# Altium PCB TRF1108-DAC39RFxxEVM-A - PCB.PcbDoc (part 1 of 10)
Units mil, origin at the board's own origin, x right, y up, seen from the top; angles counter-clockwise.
Board outline 4951.22 x 2726.56 mil, 16 copper layers (Top Layer, L2 GND1, L3 PWR1, L4 GND2, L5 PWR2, L6 GND3, L7 Ctrl Signal 1, L8 GND4, L9 GND5, L10 Ctrl Signal 2, L11 GND6, L12 PWR3, L13 GND7, L14 PWR4, L15 GND8, Bottom Layer), stack 80.2 mil thick; 705 components, 433 nets, 3633 pads, 1678 vias.
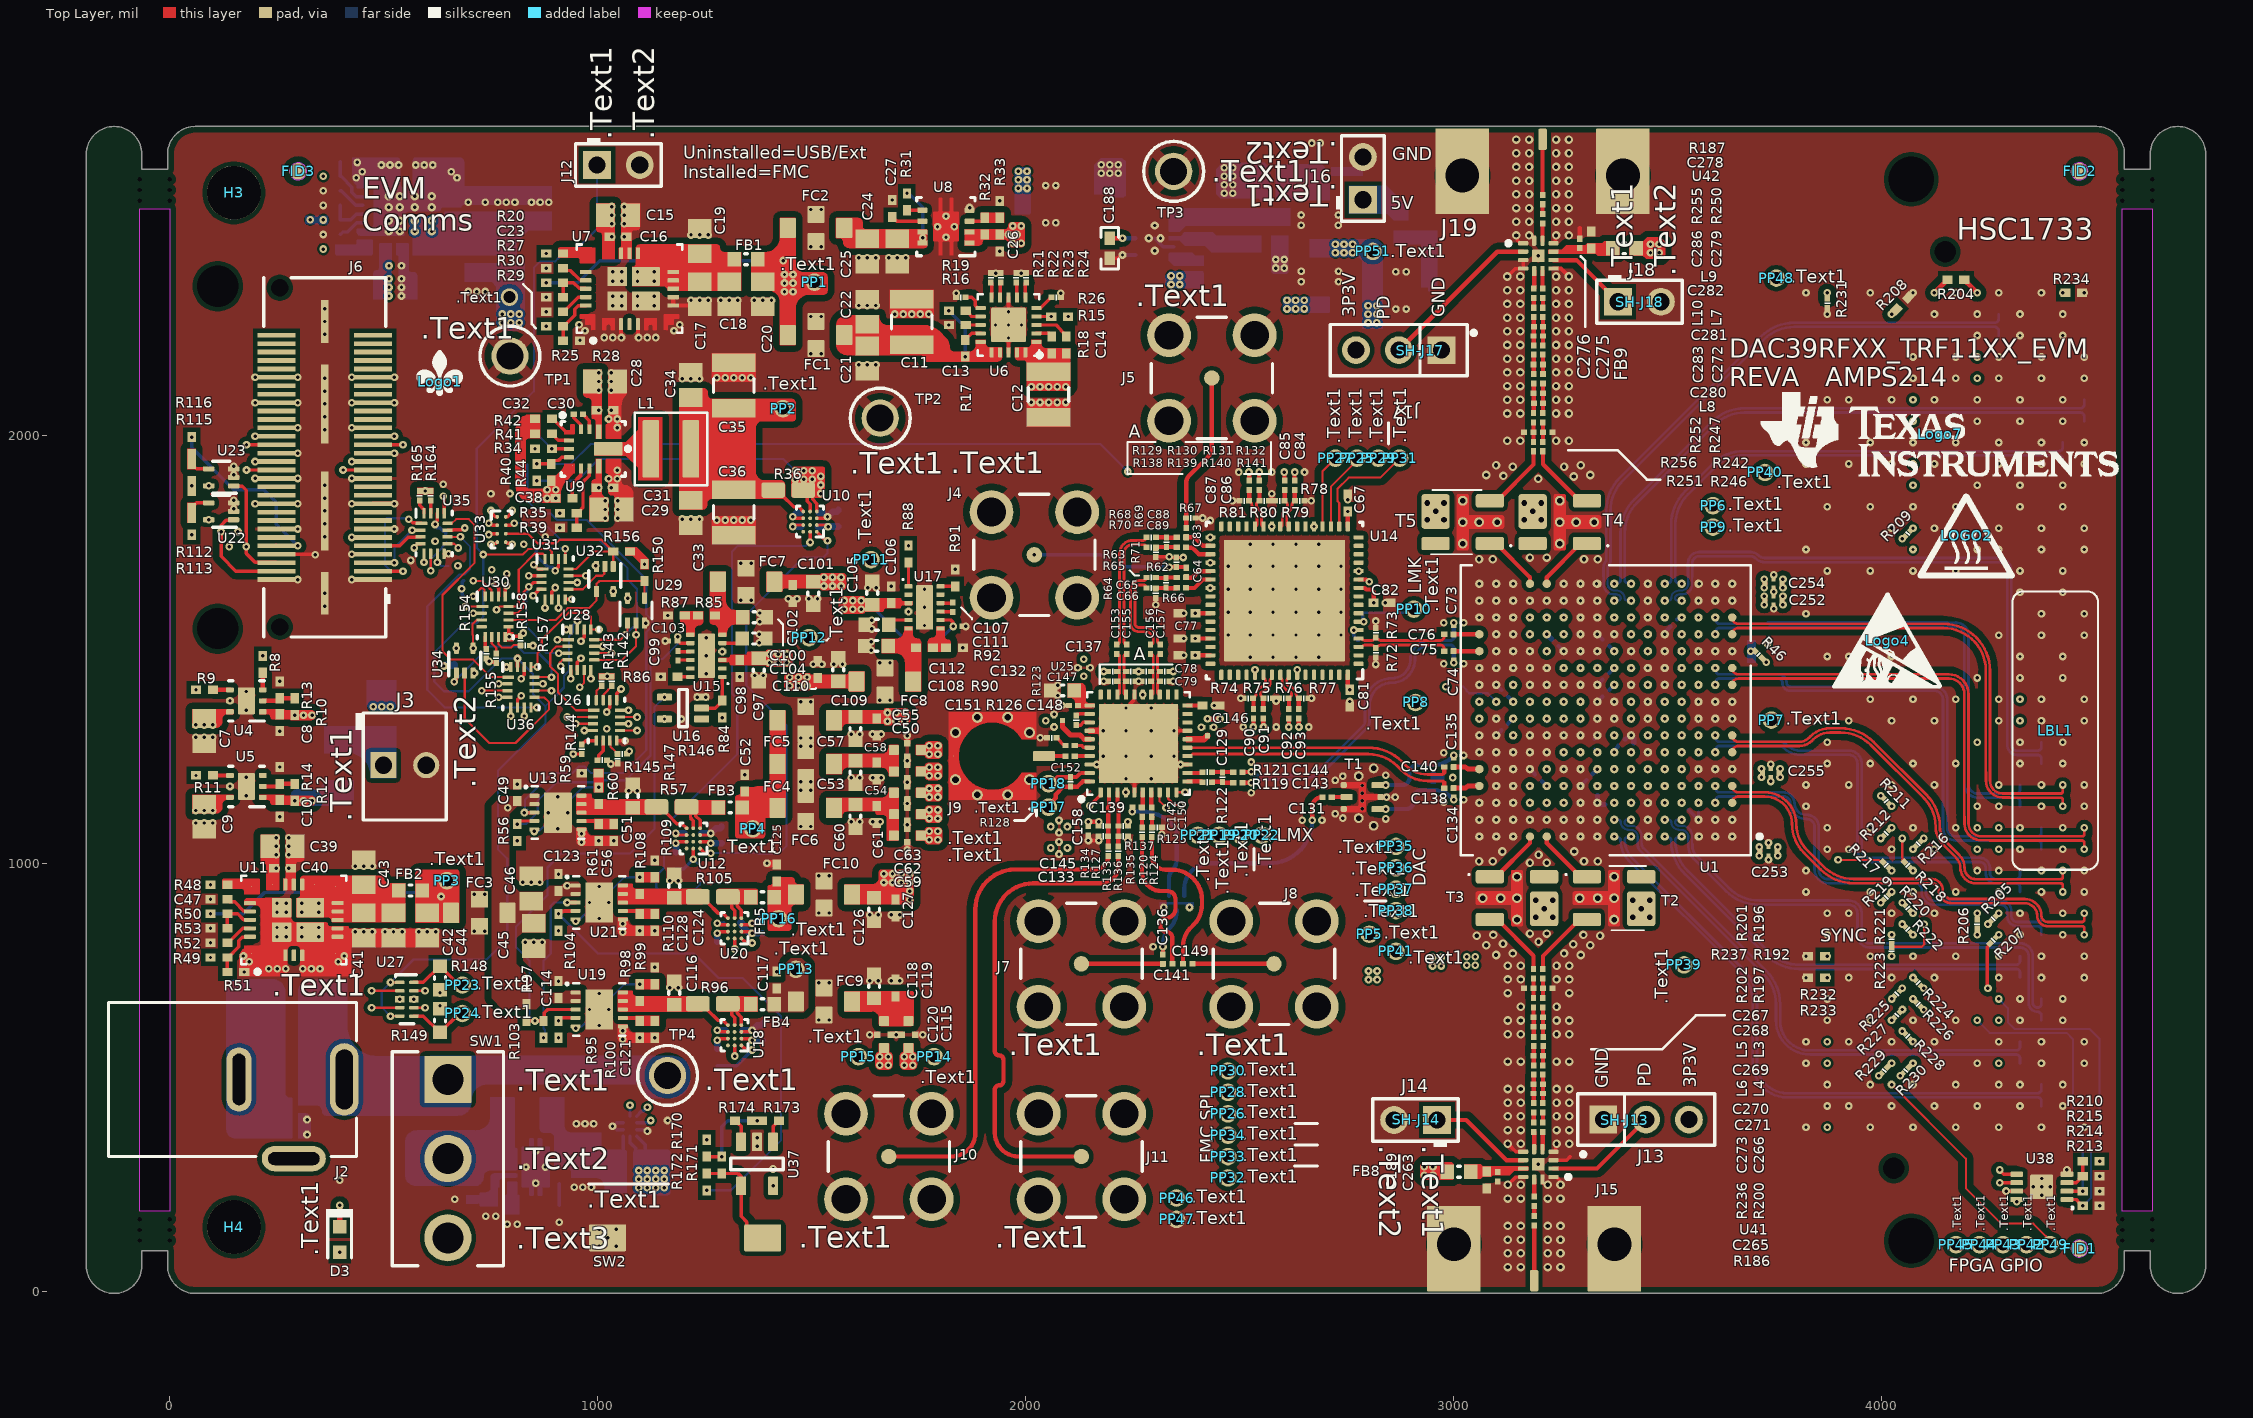
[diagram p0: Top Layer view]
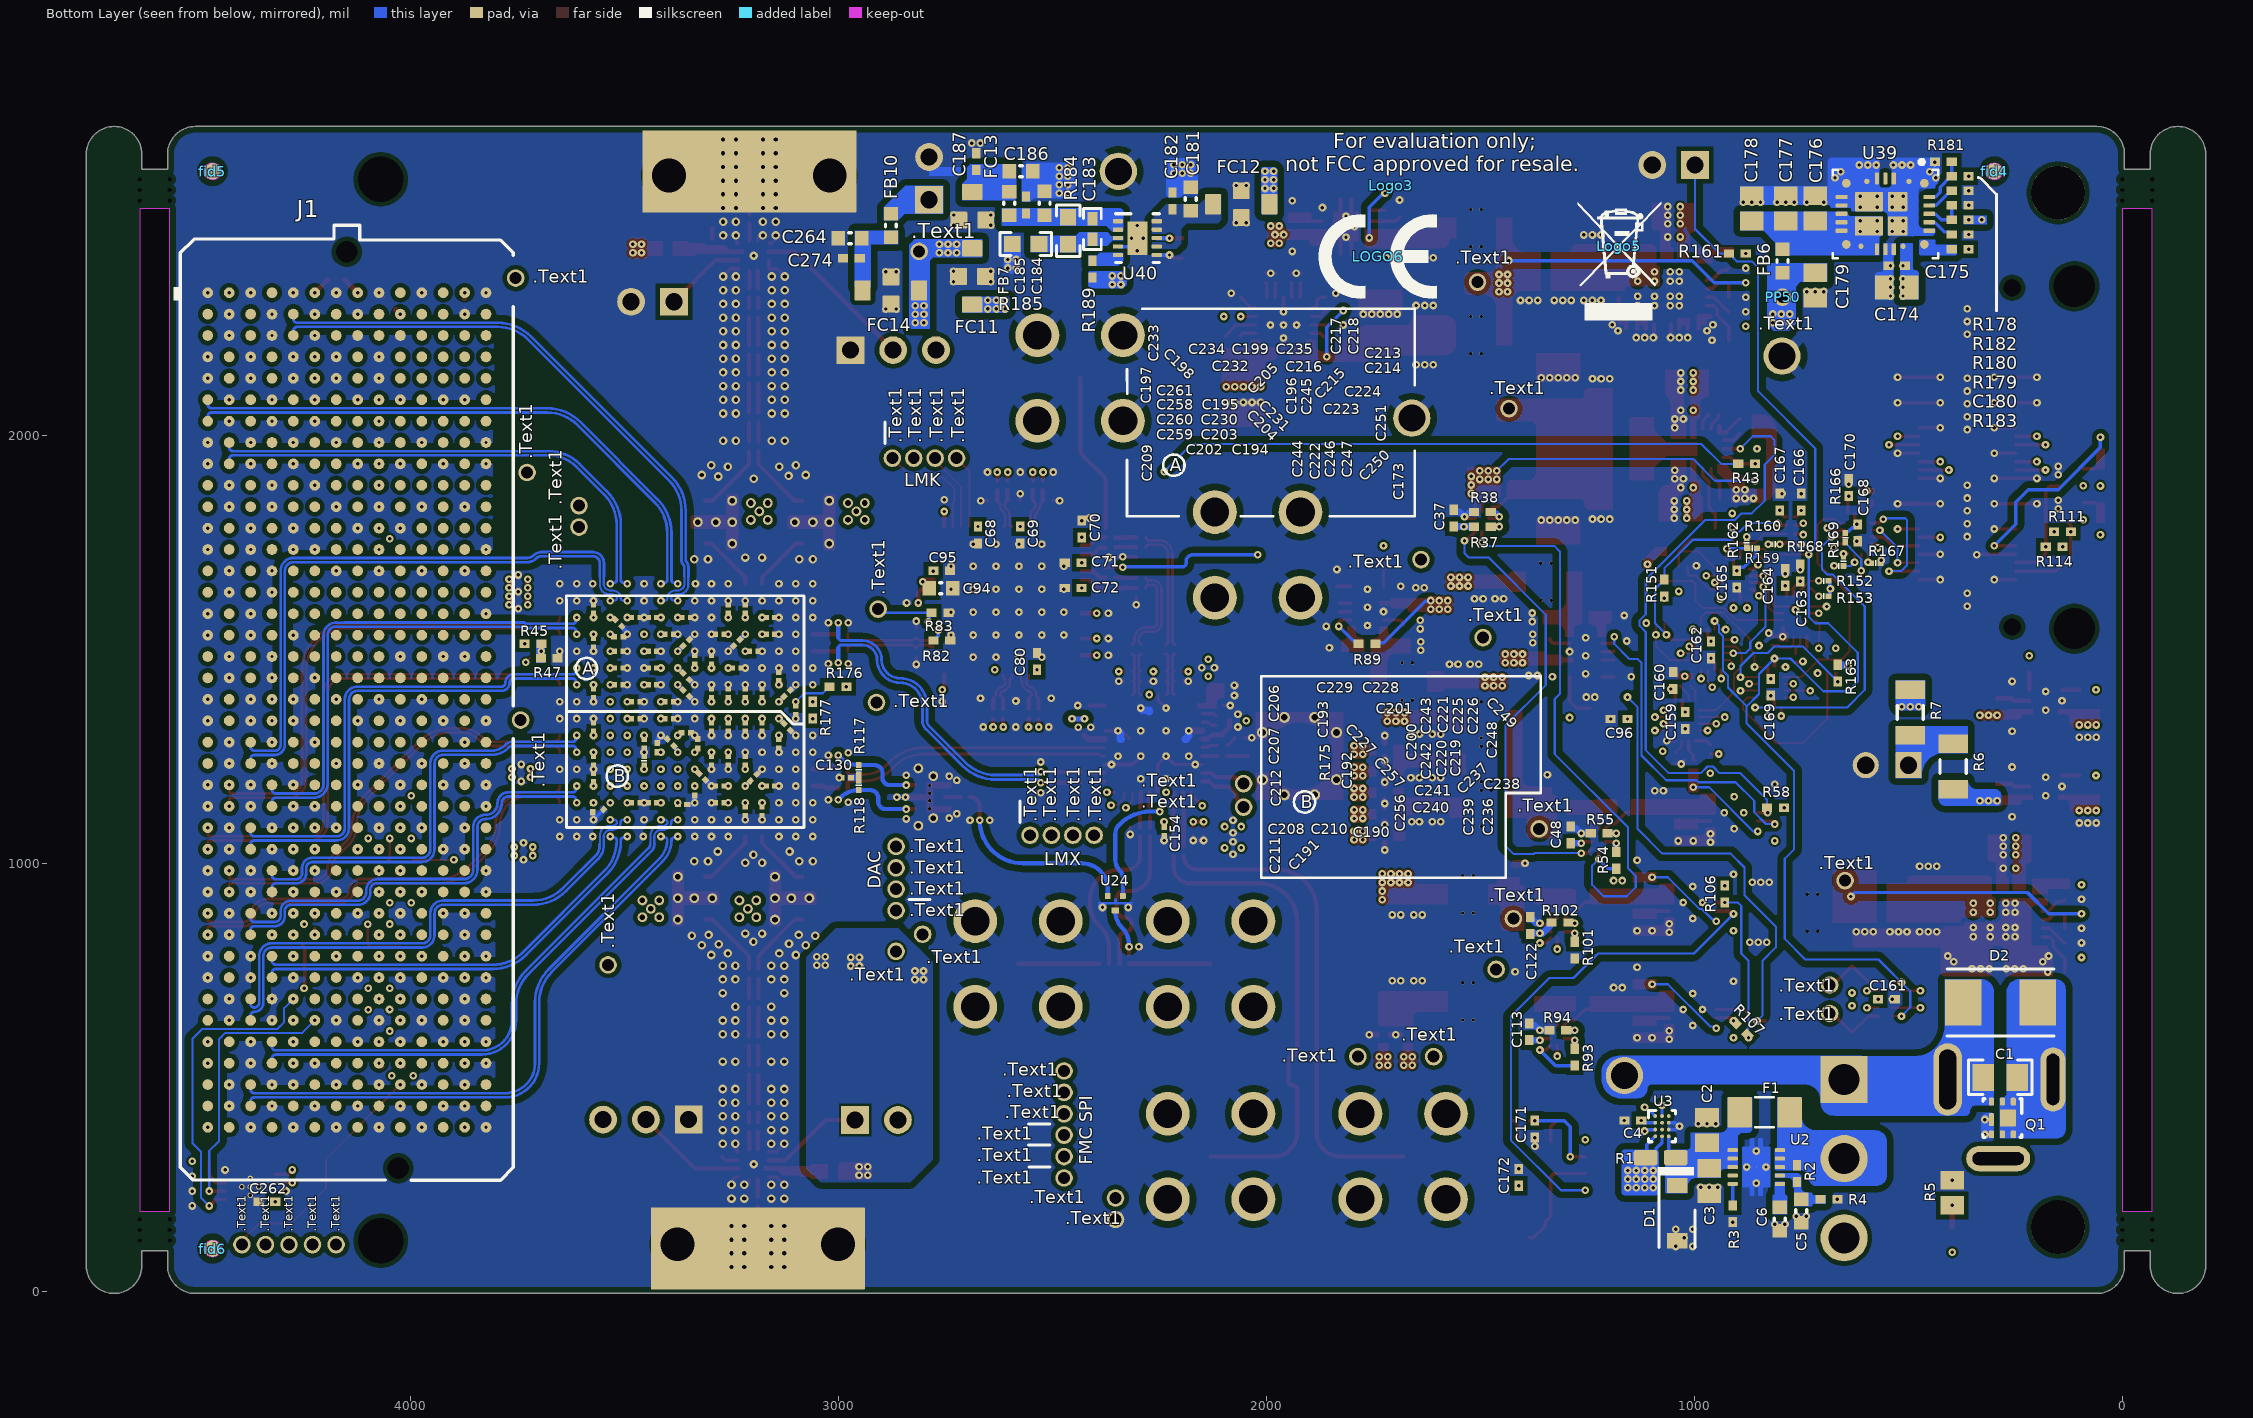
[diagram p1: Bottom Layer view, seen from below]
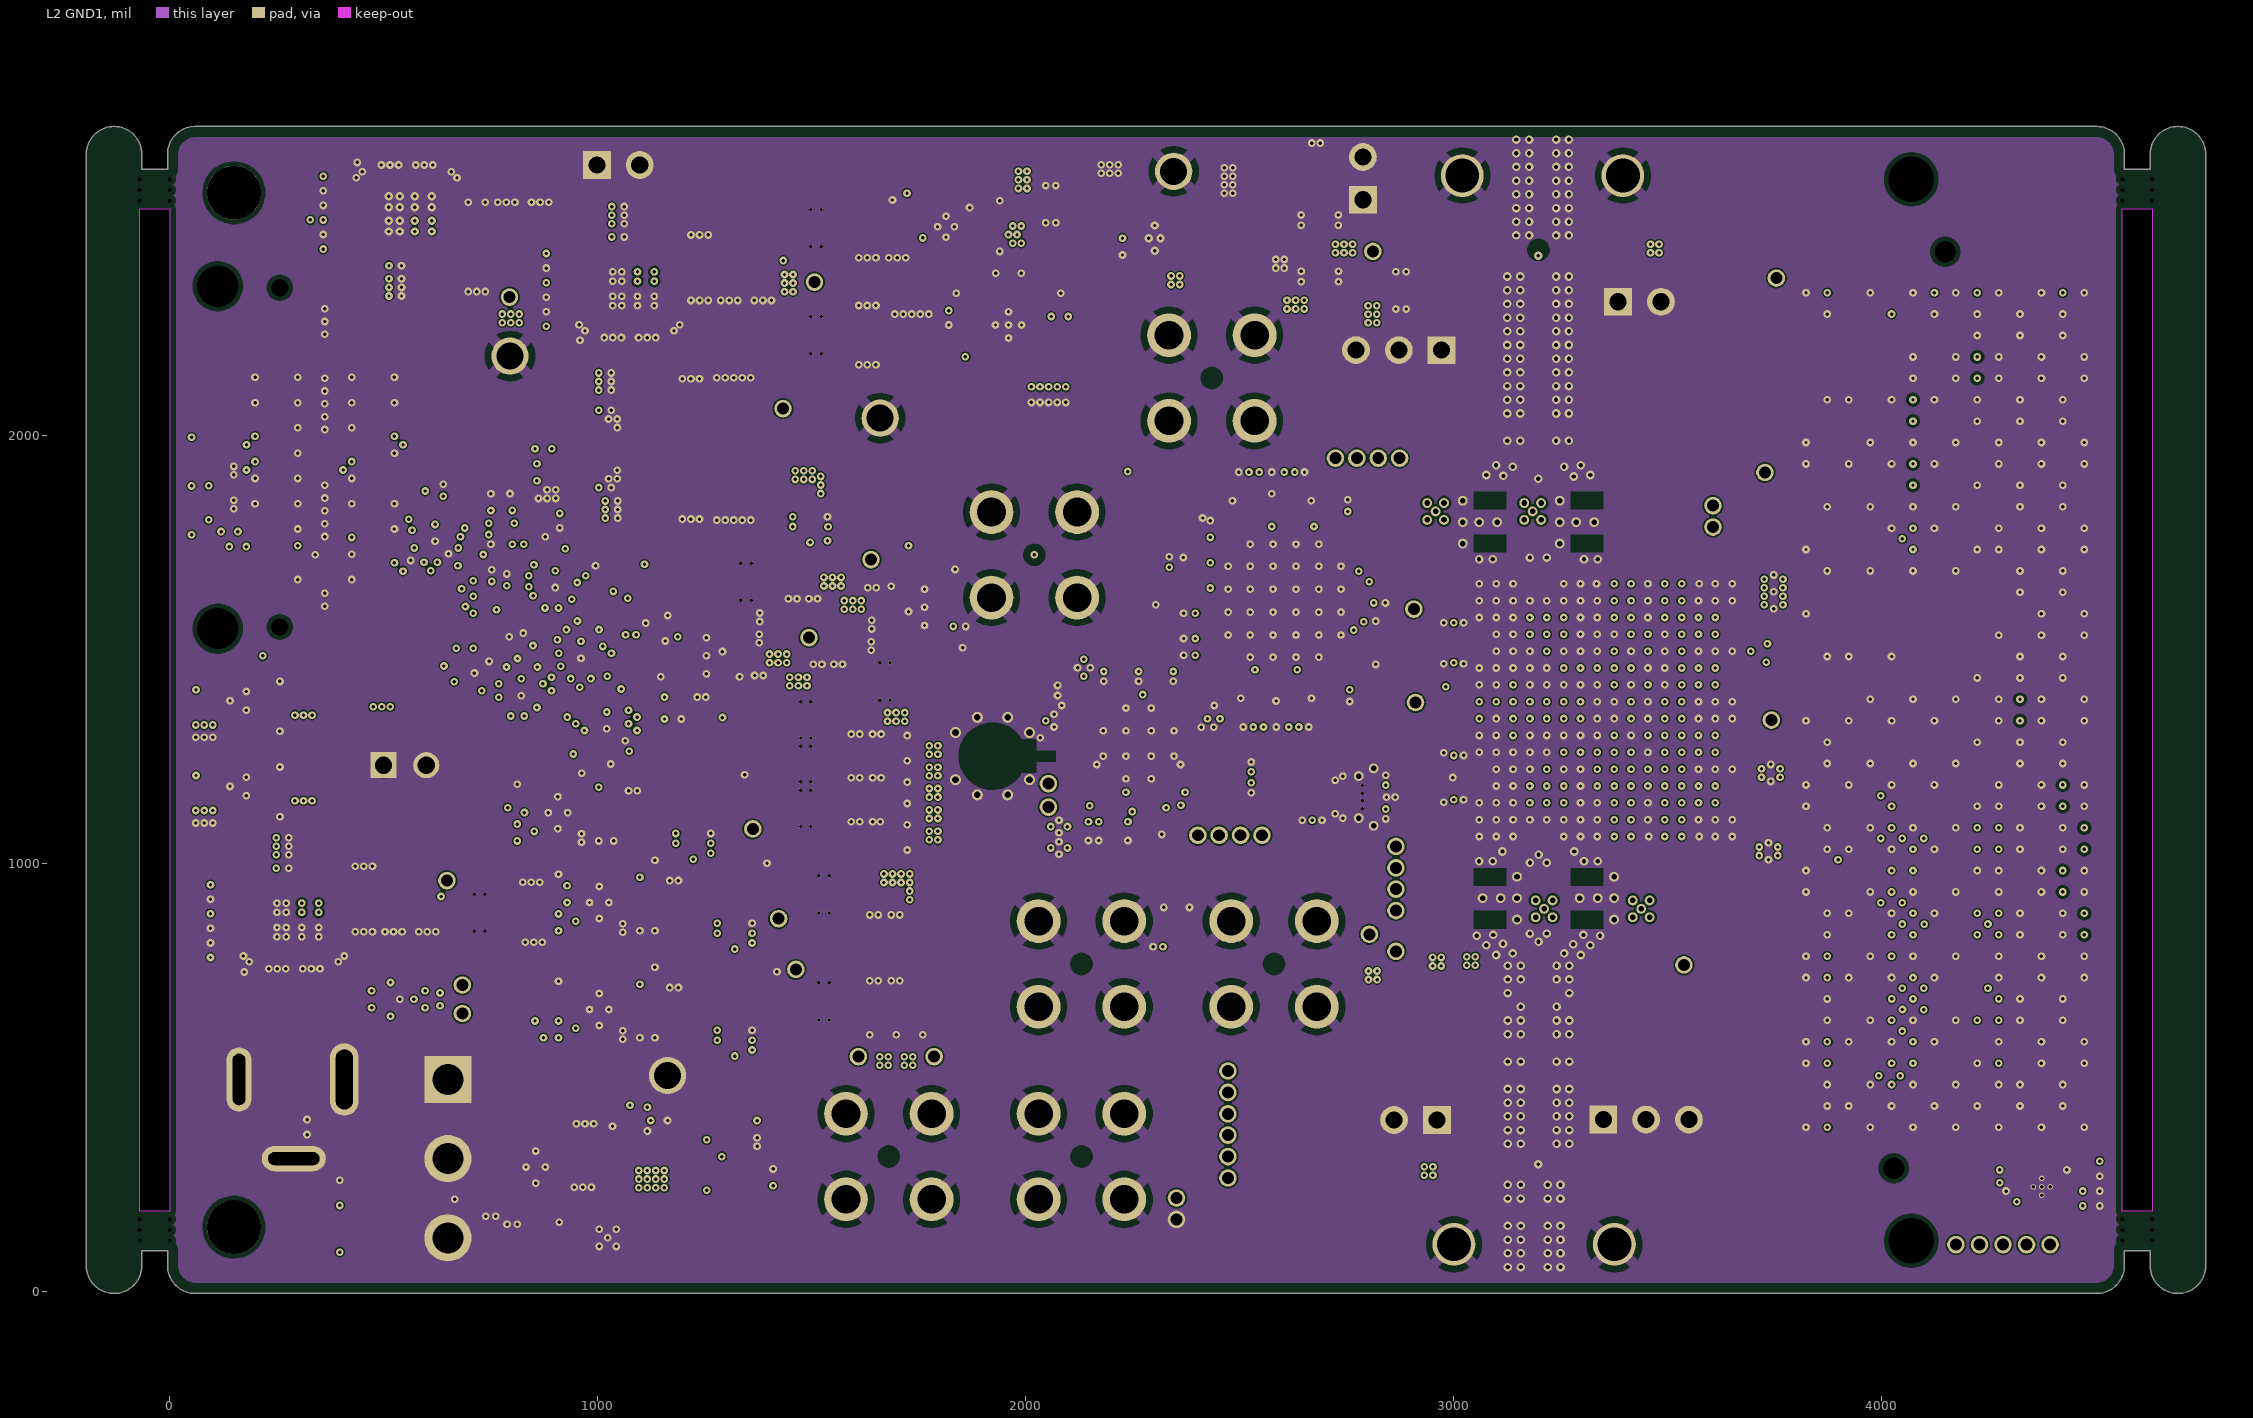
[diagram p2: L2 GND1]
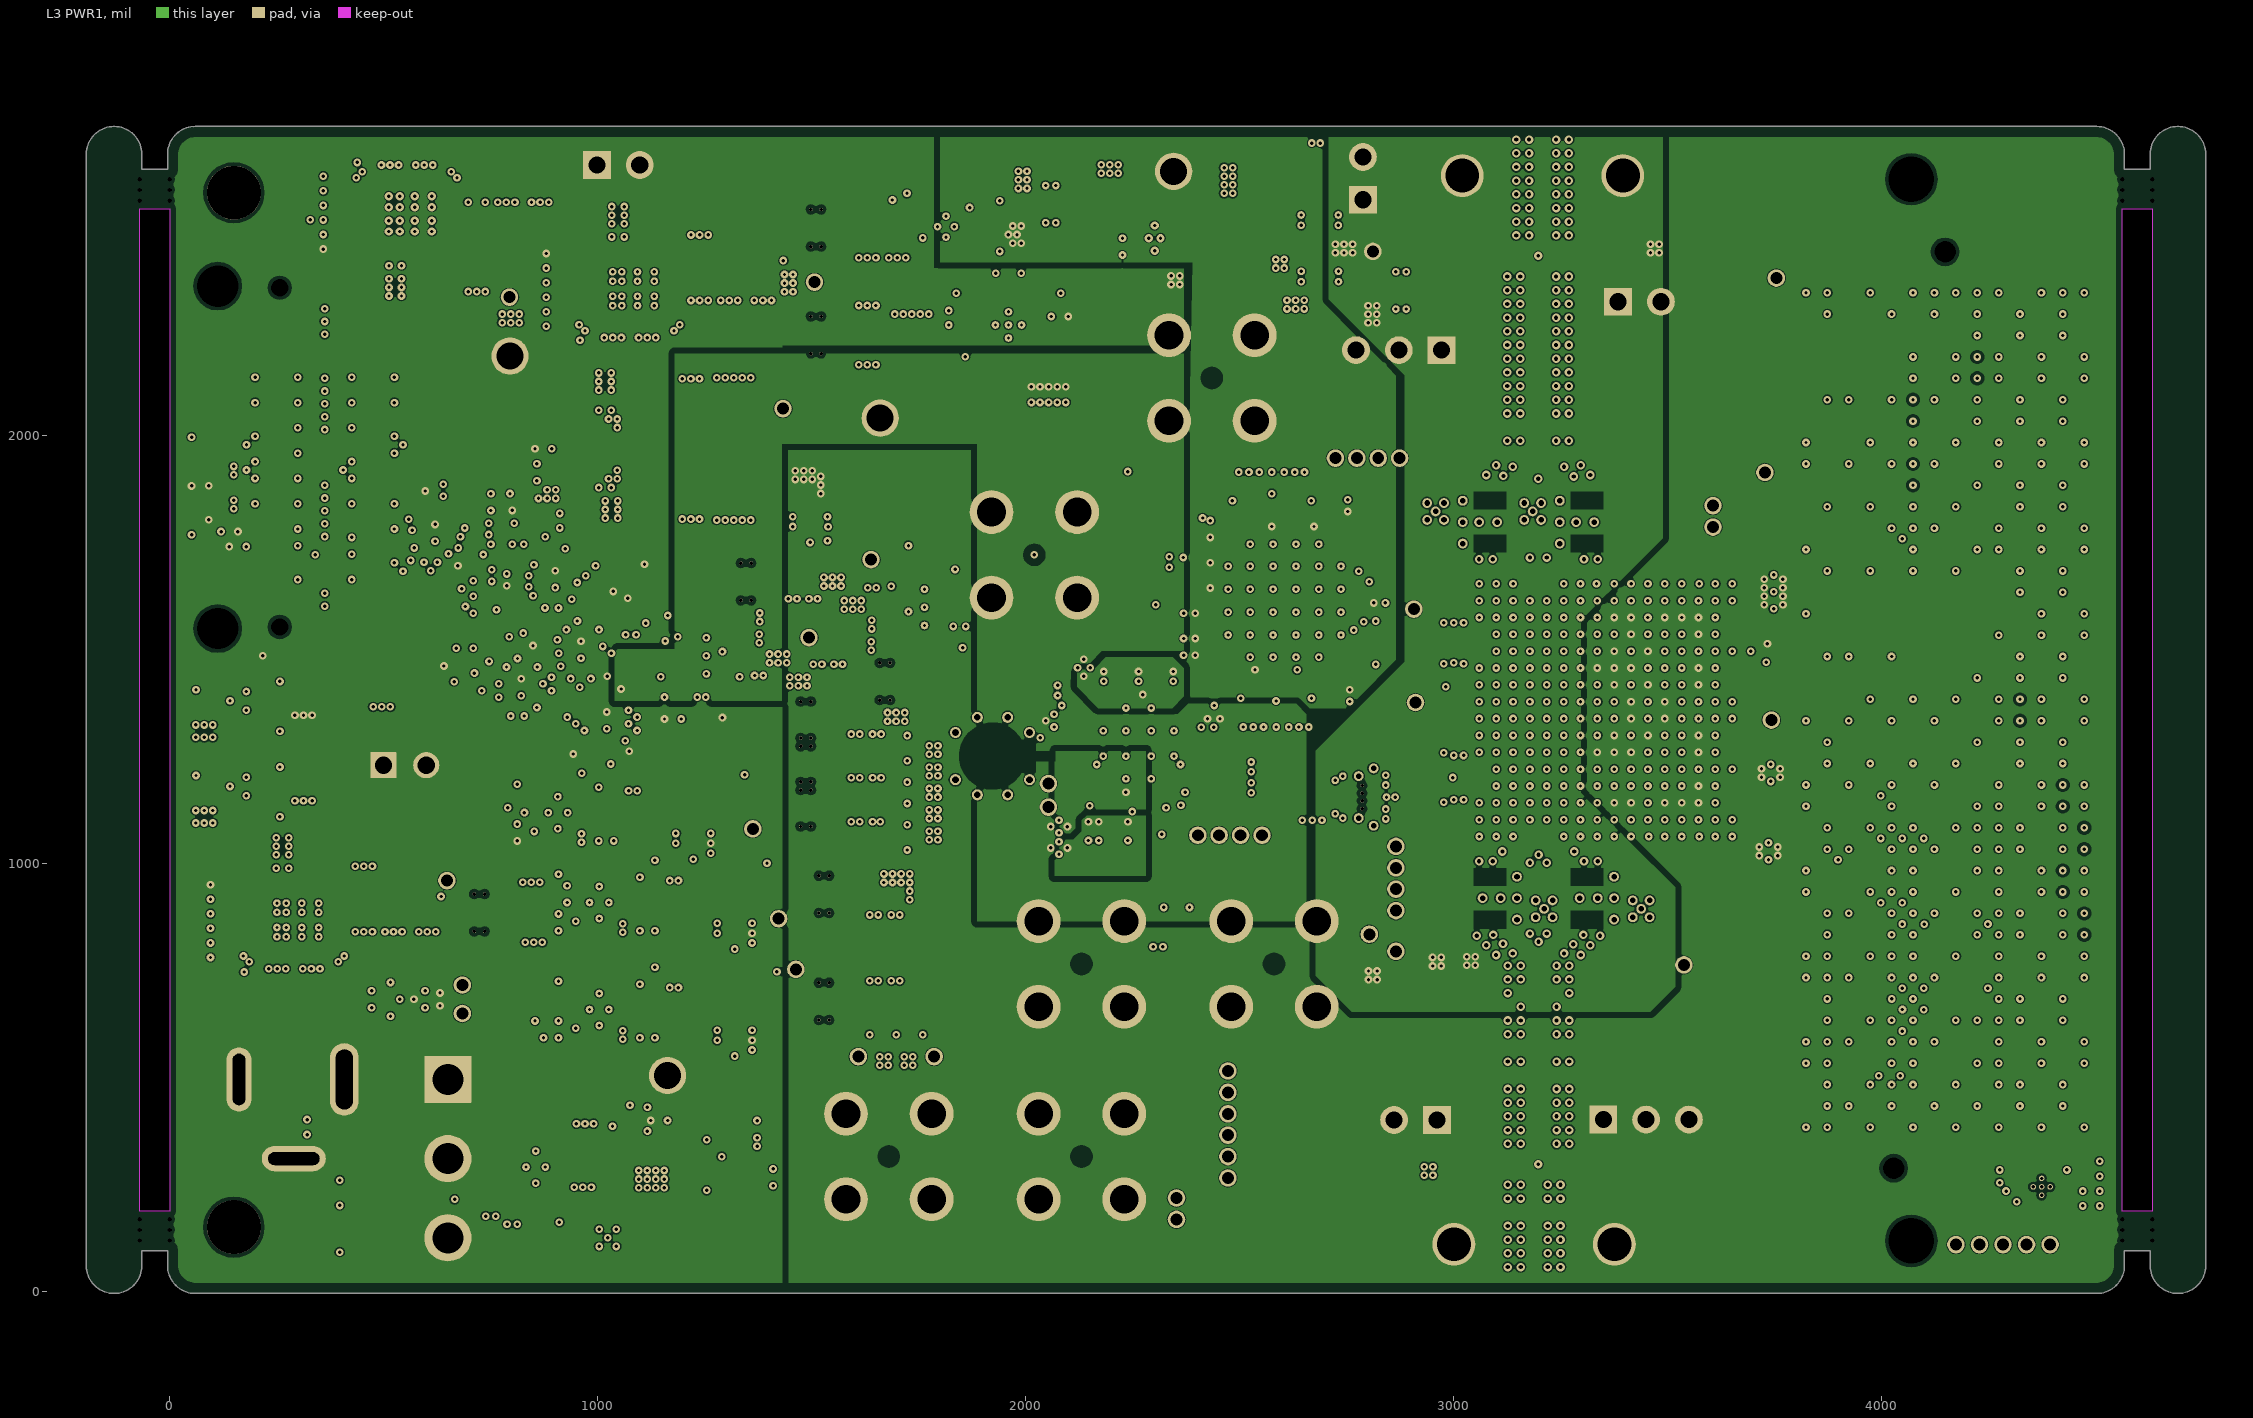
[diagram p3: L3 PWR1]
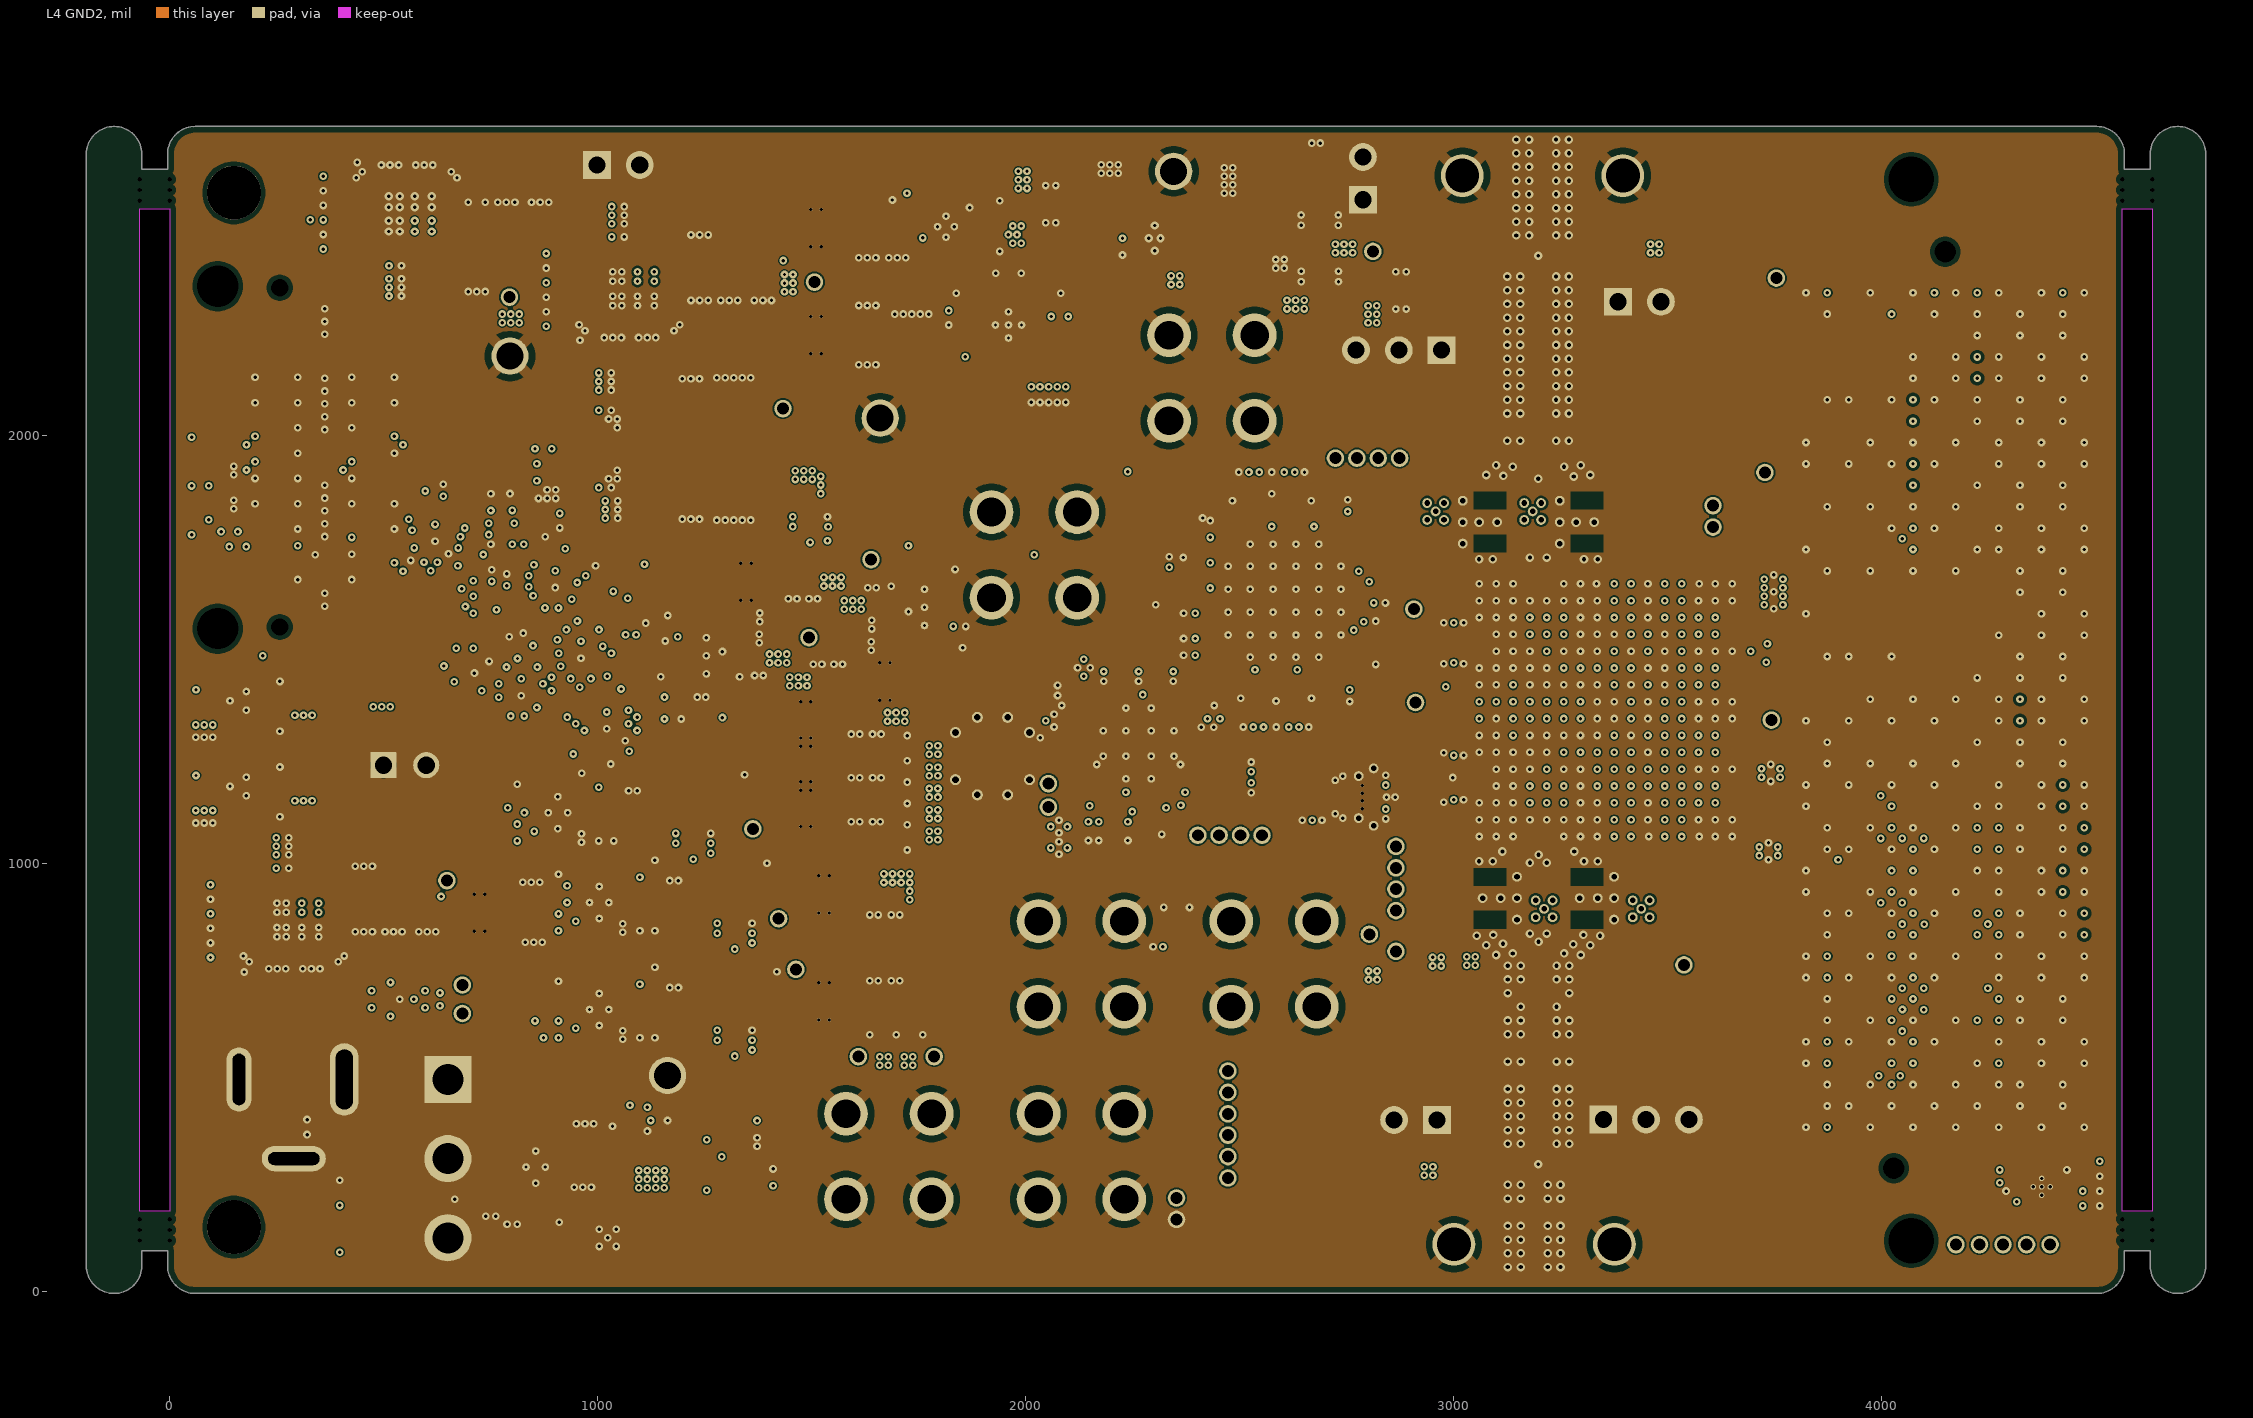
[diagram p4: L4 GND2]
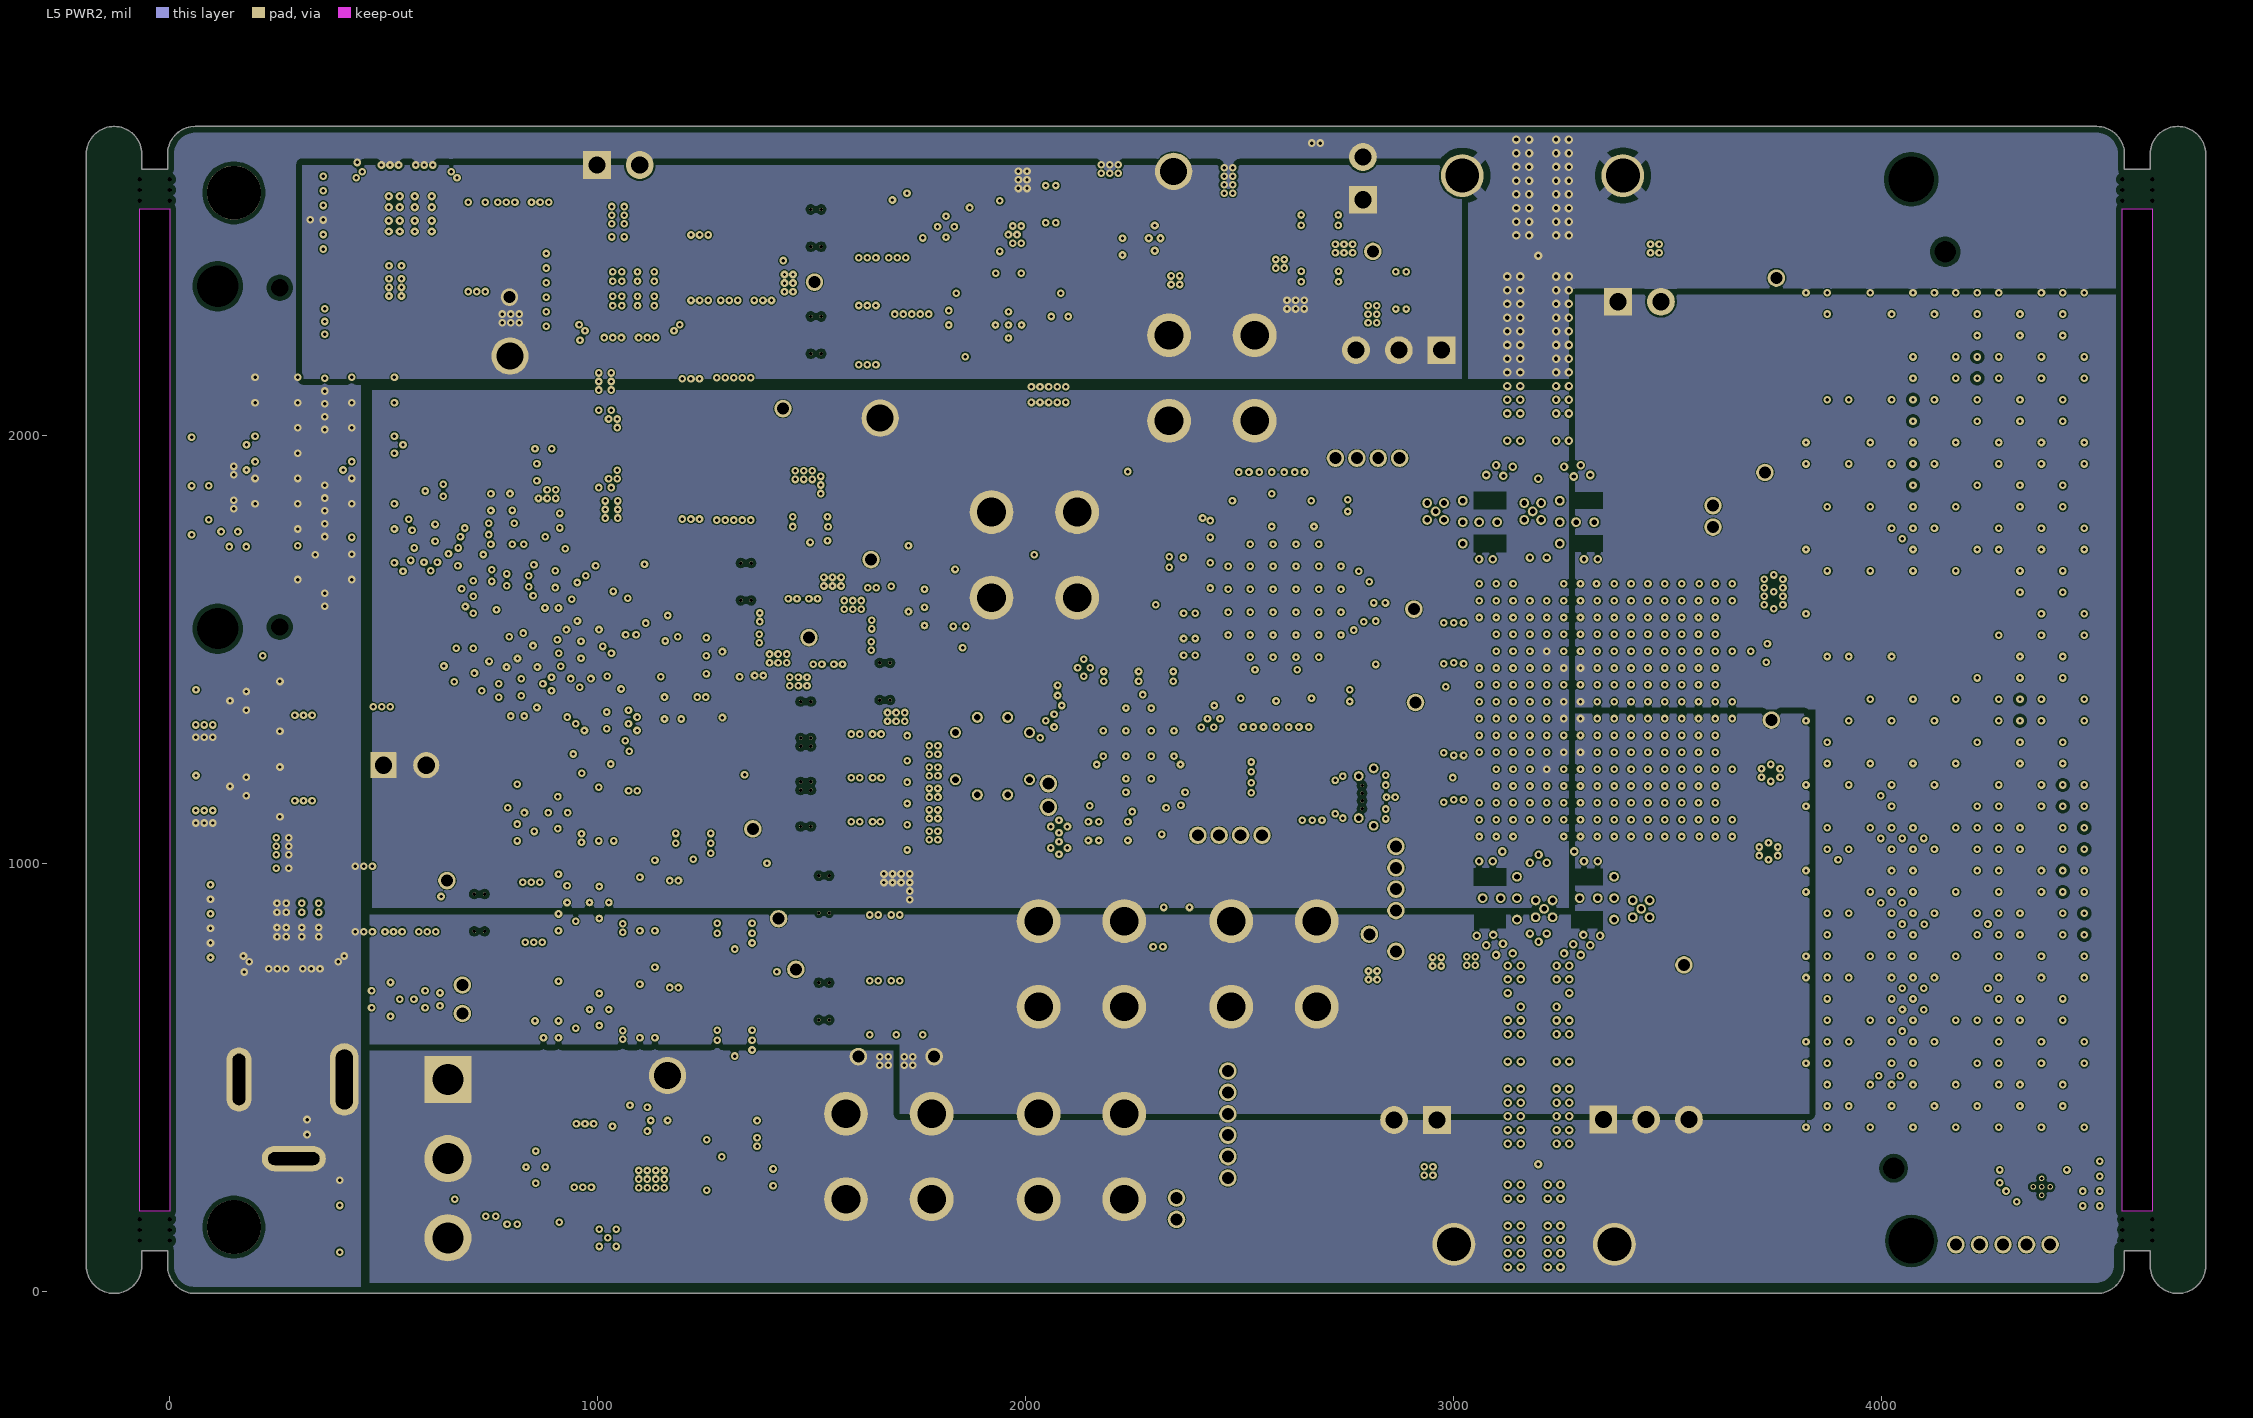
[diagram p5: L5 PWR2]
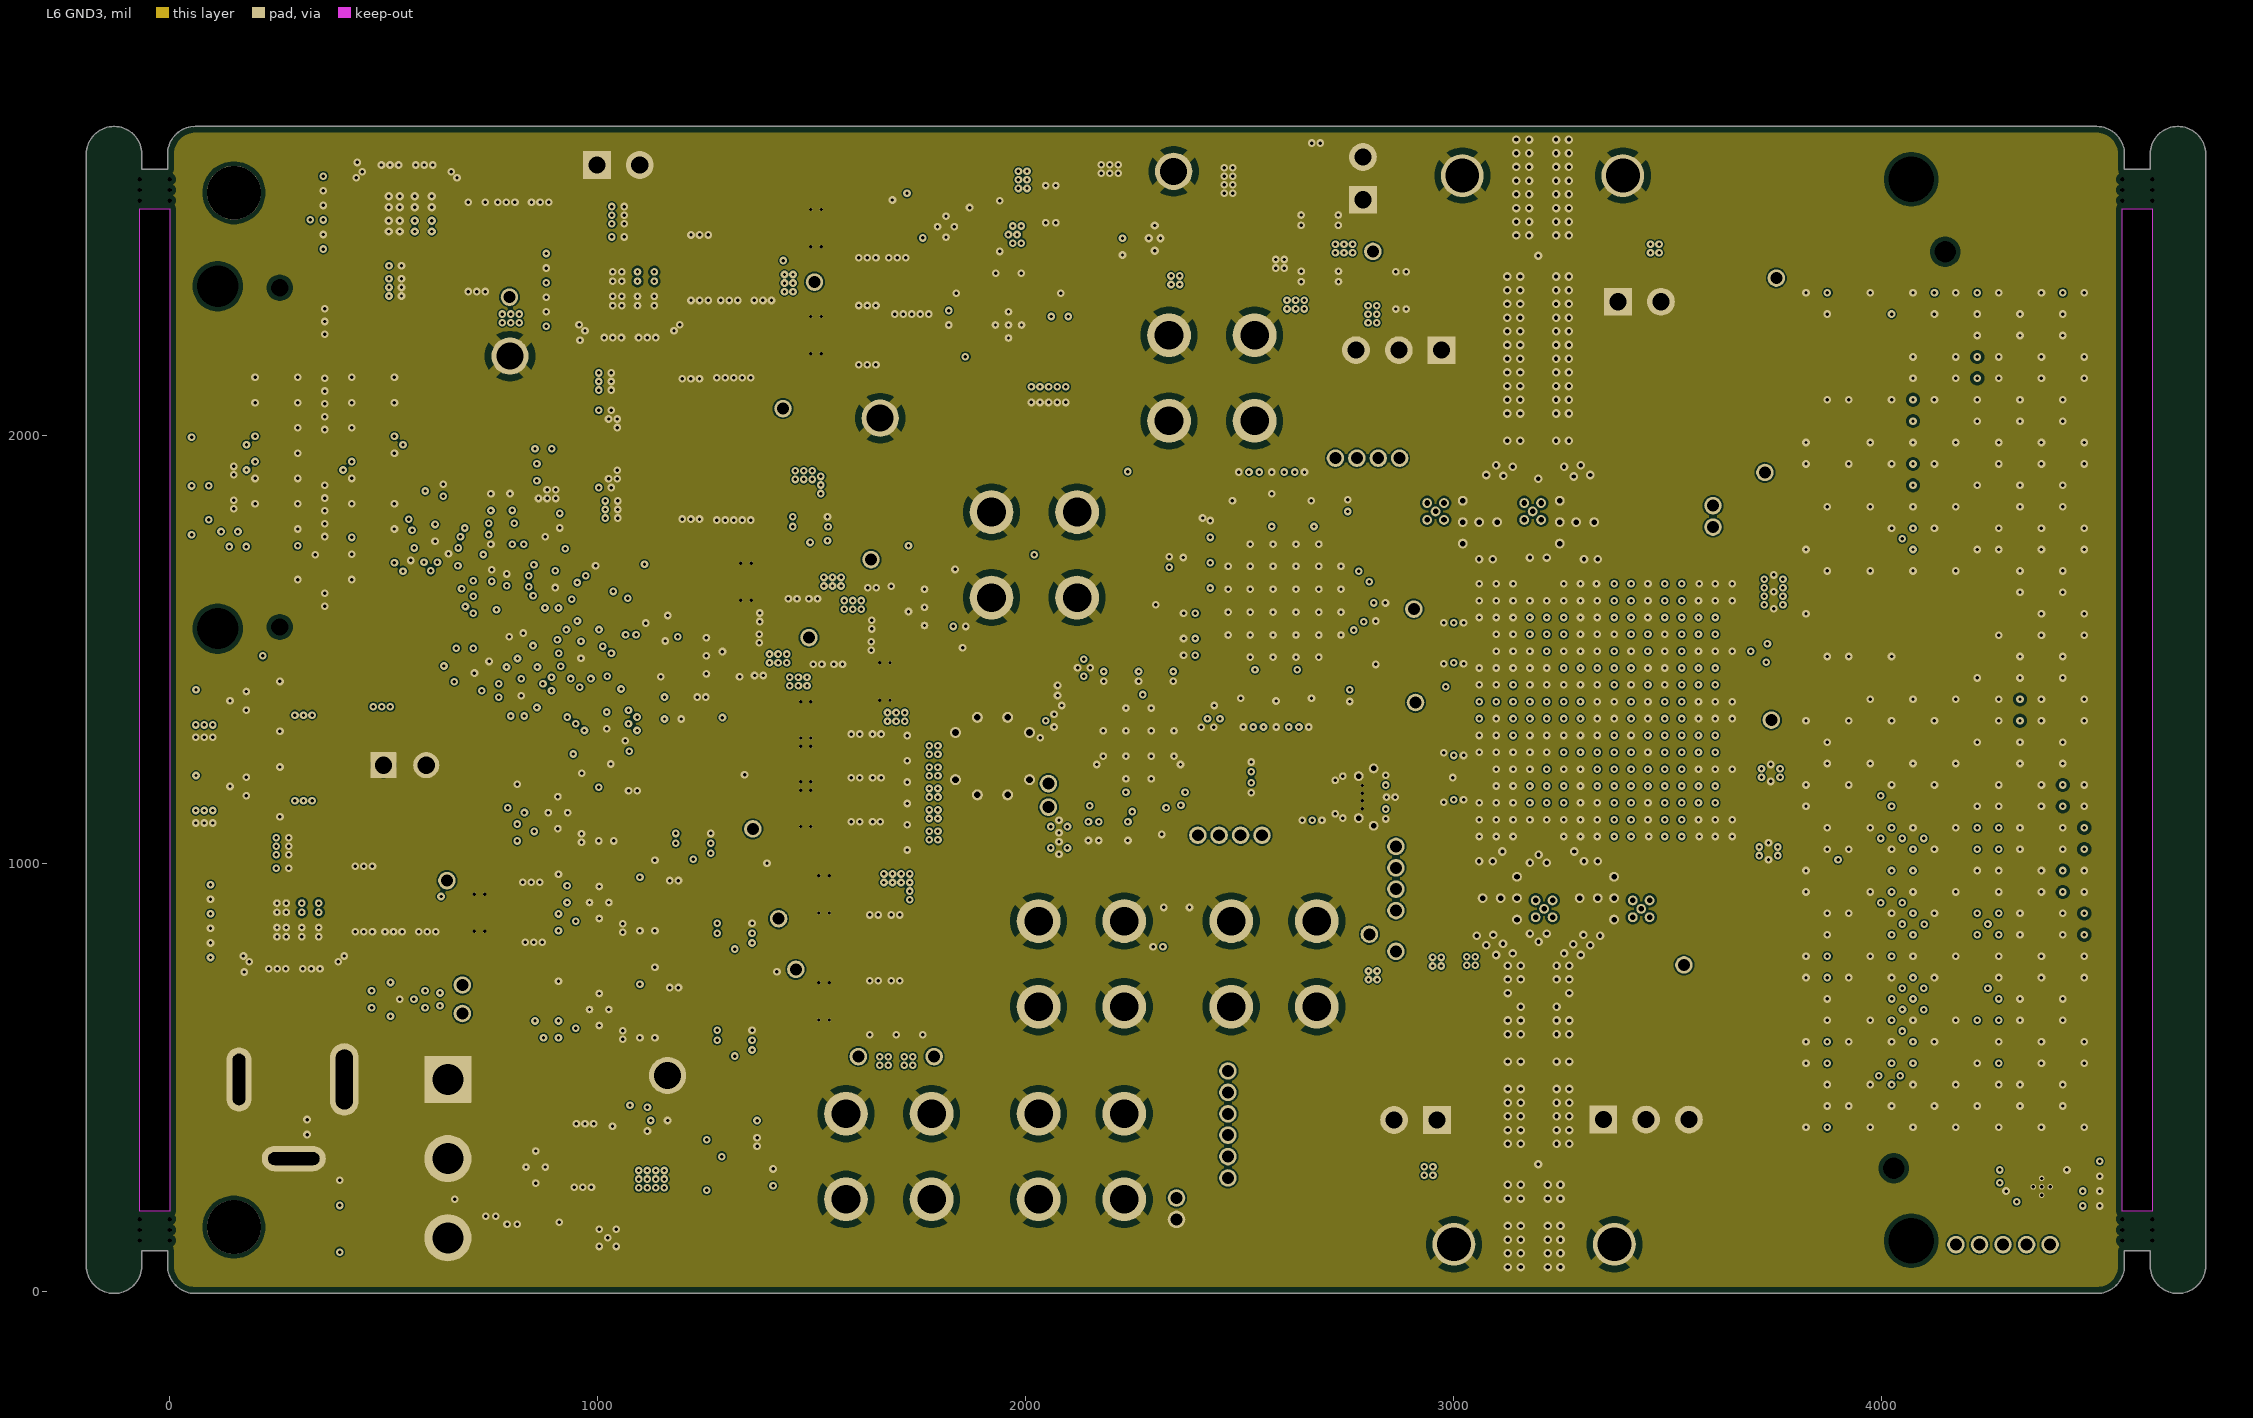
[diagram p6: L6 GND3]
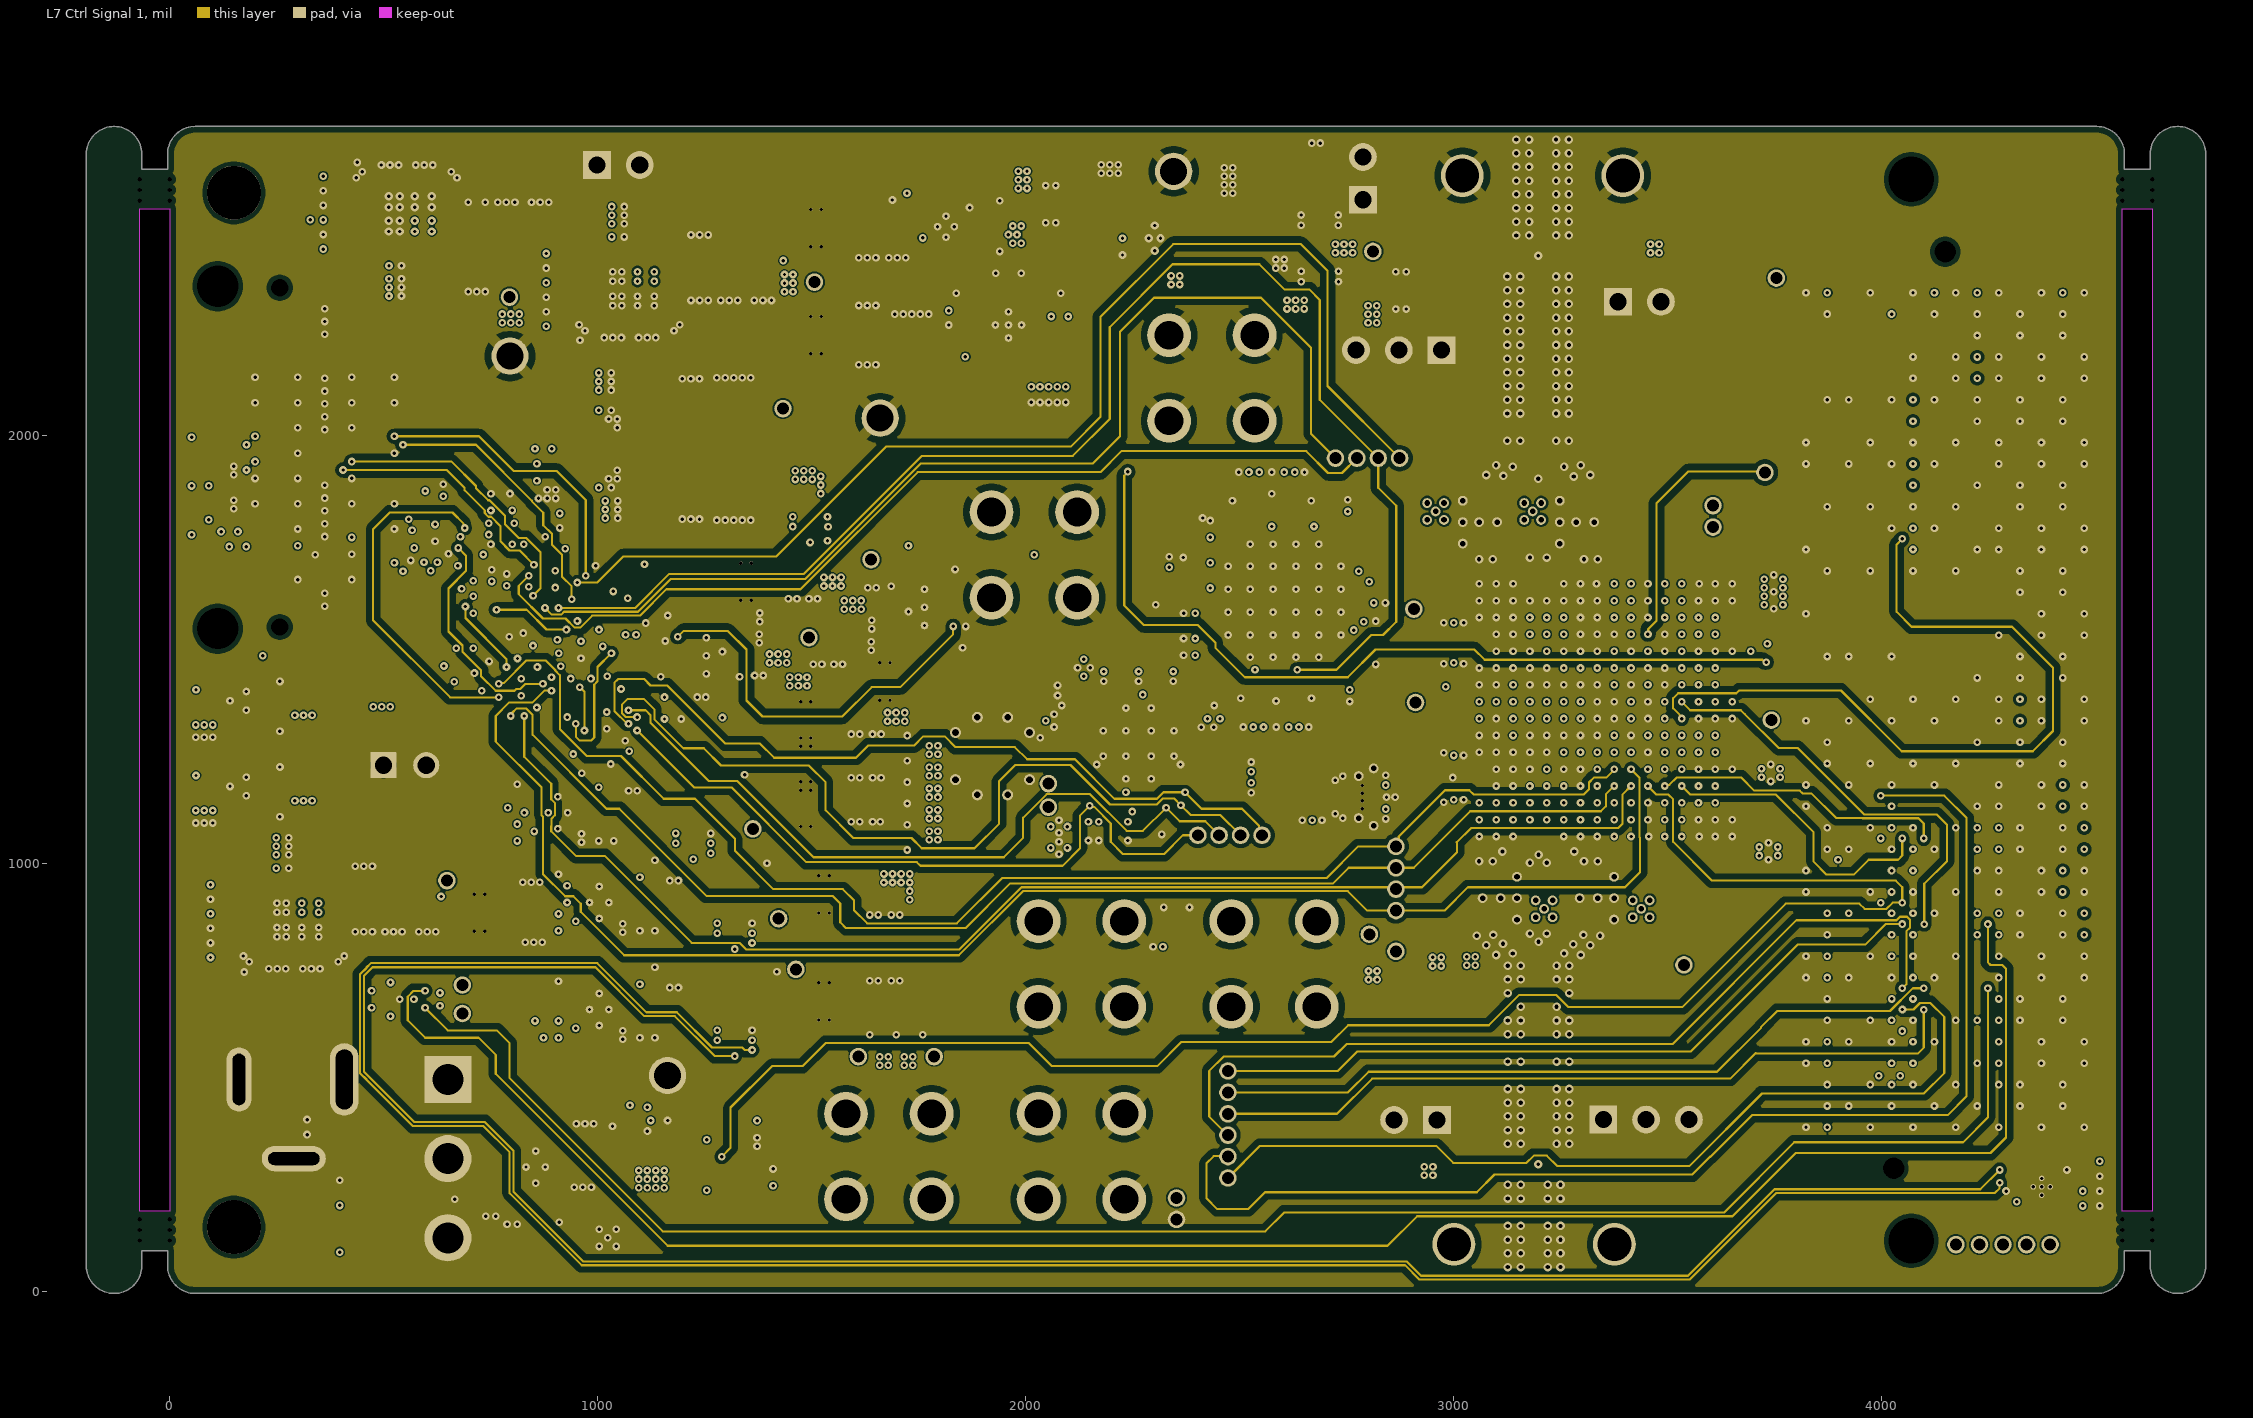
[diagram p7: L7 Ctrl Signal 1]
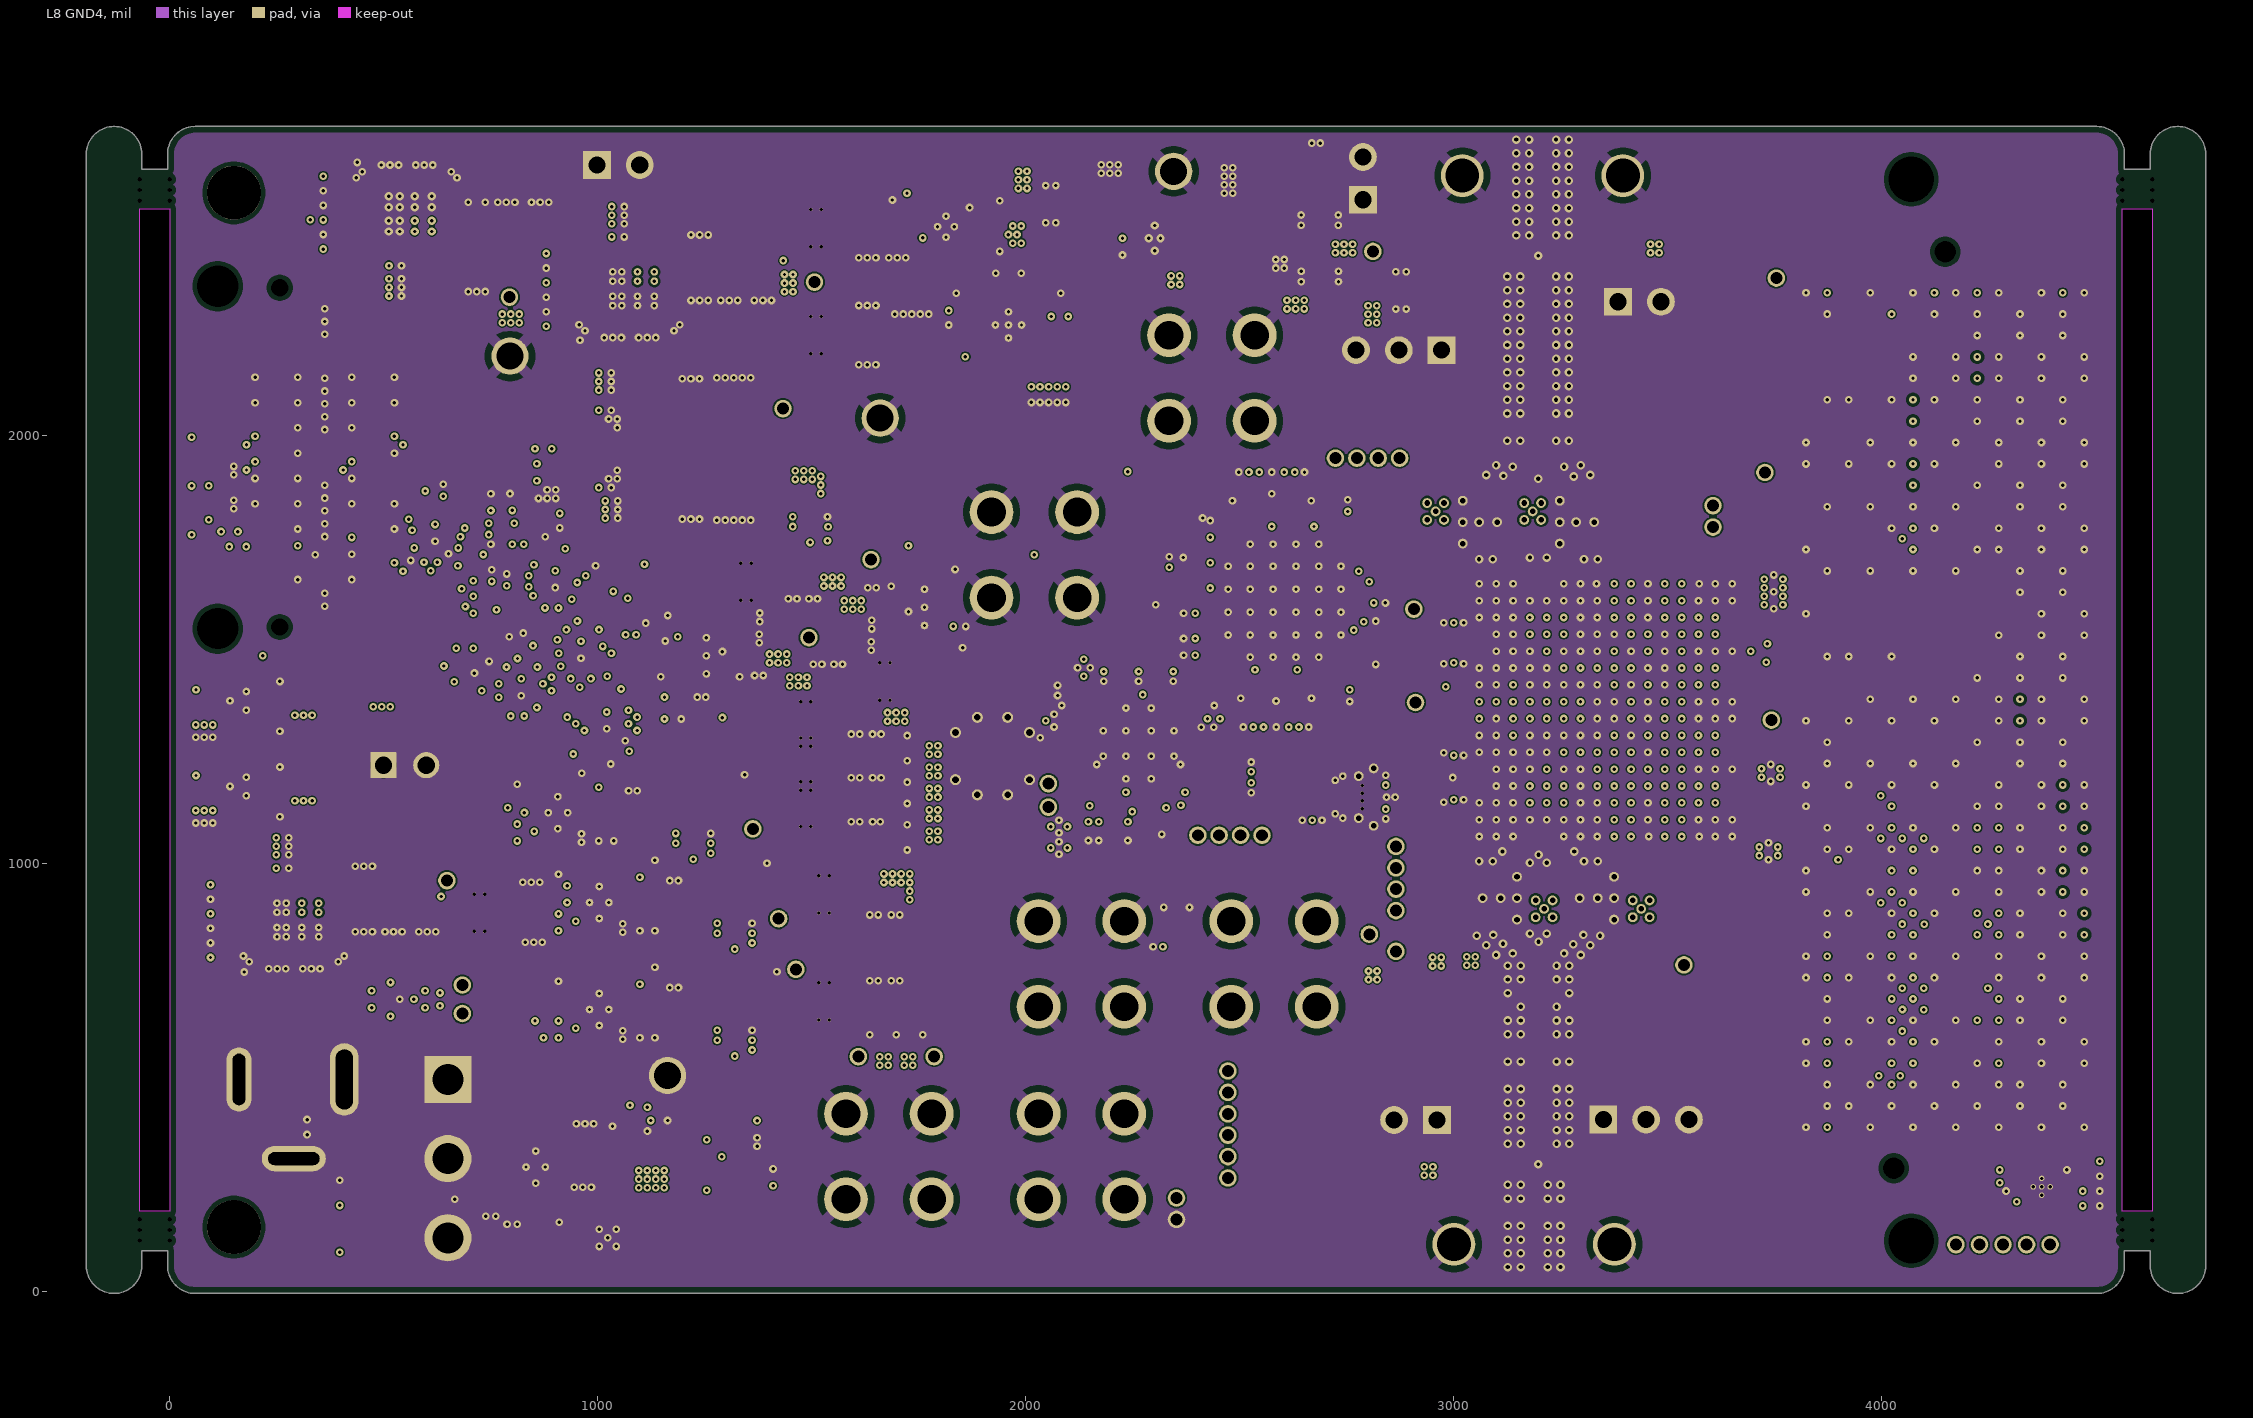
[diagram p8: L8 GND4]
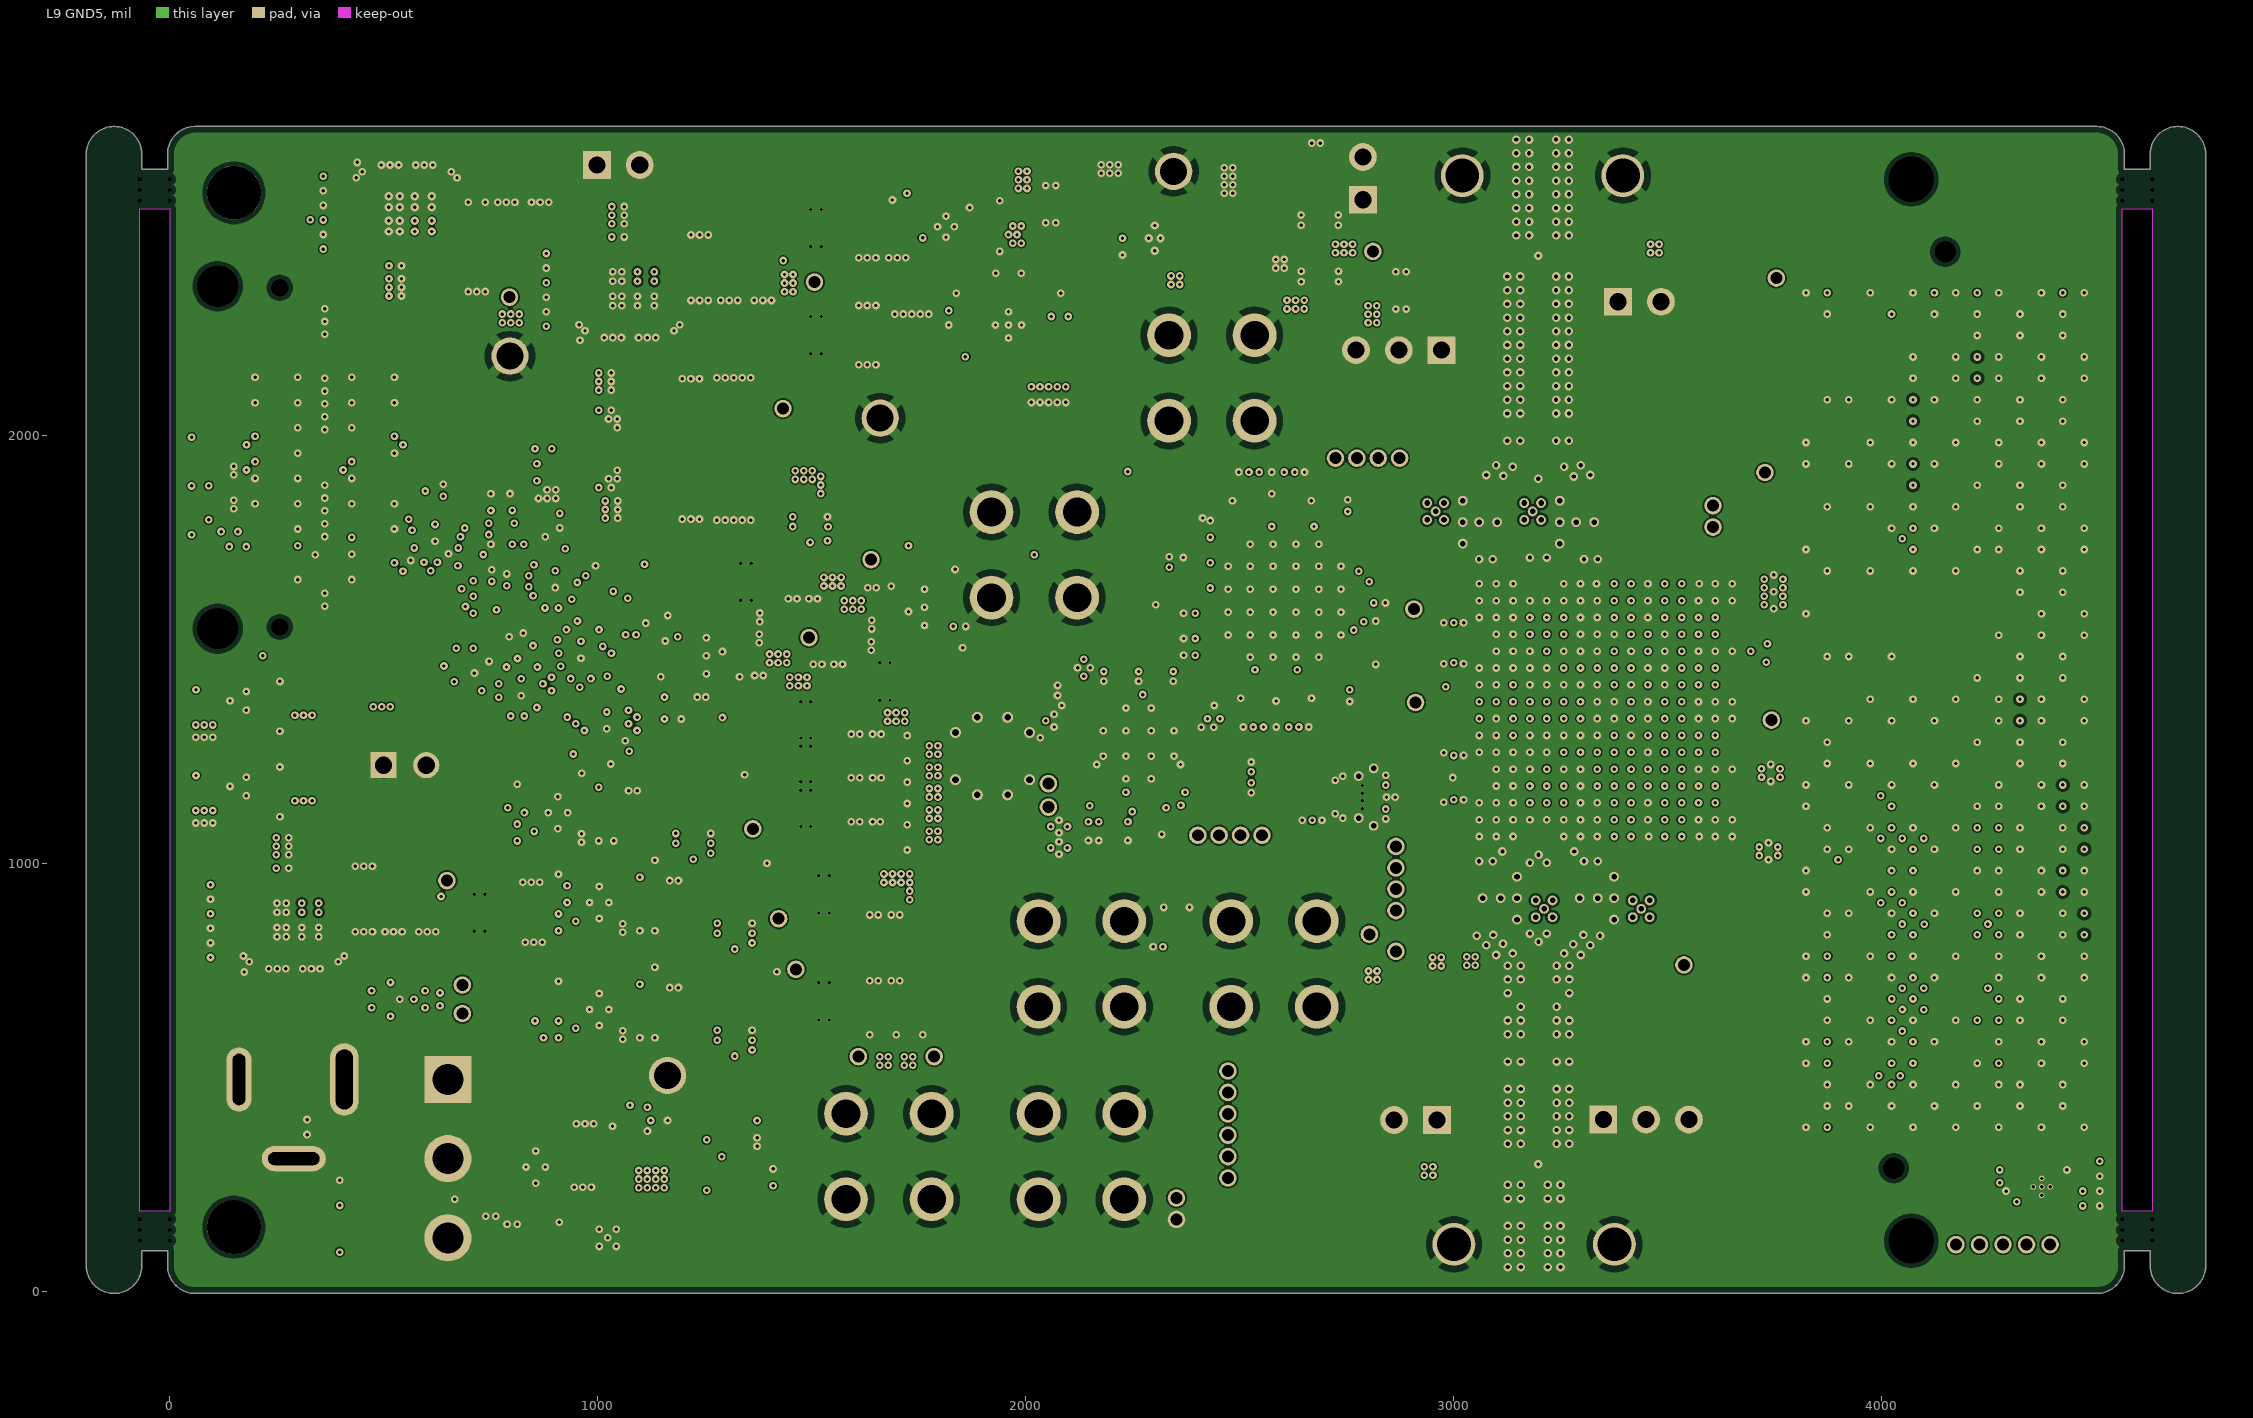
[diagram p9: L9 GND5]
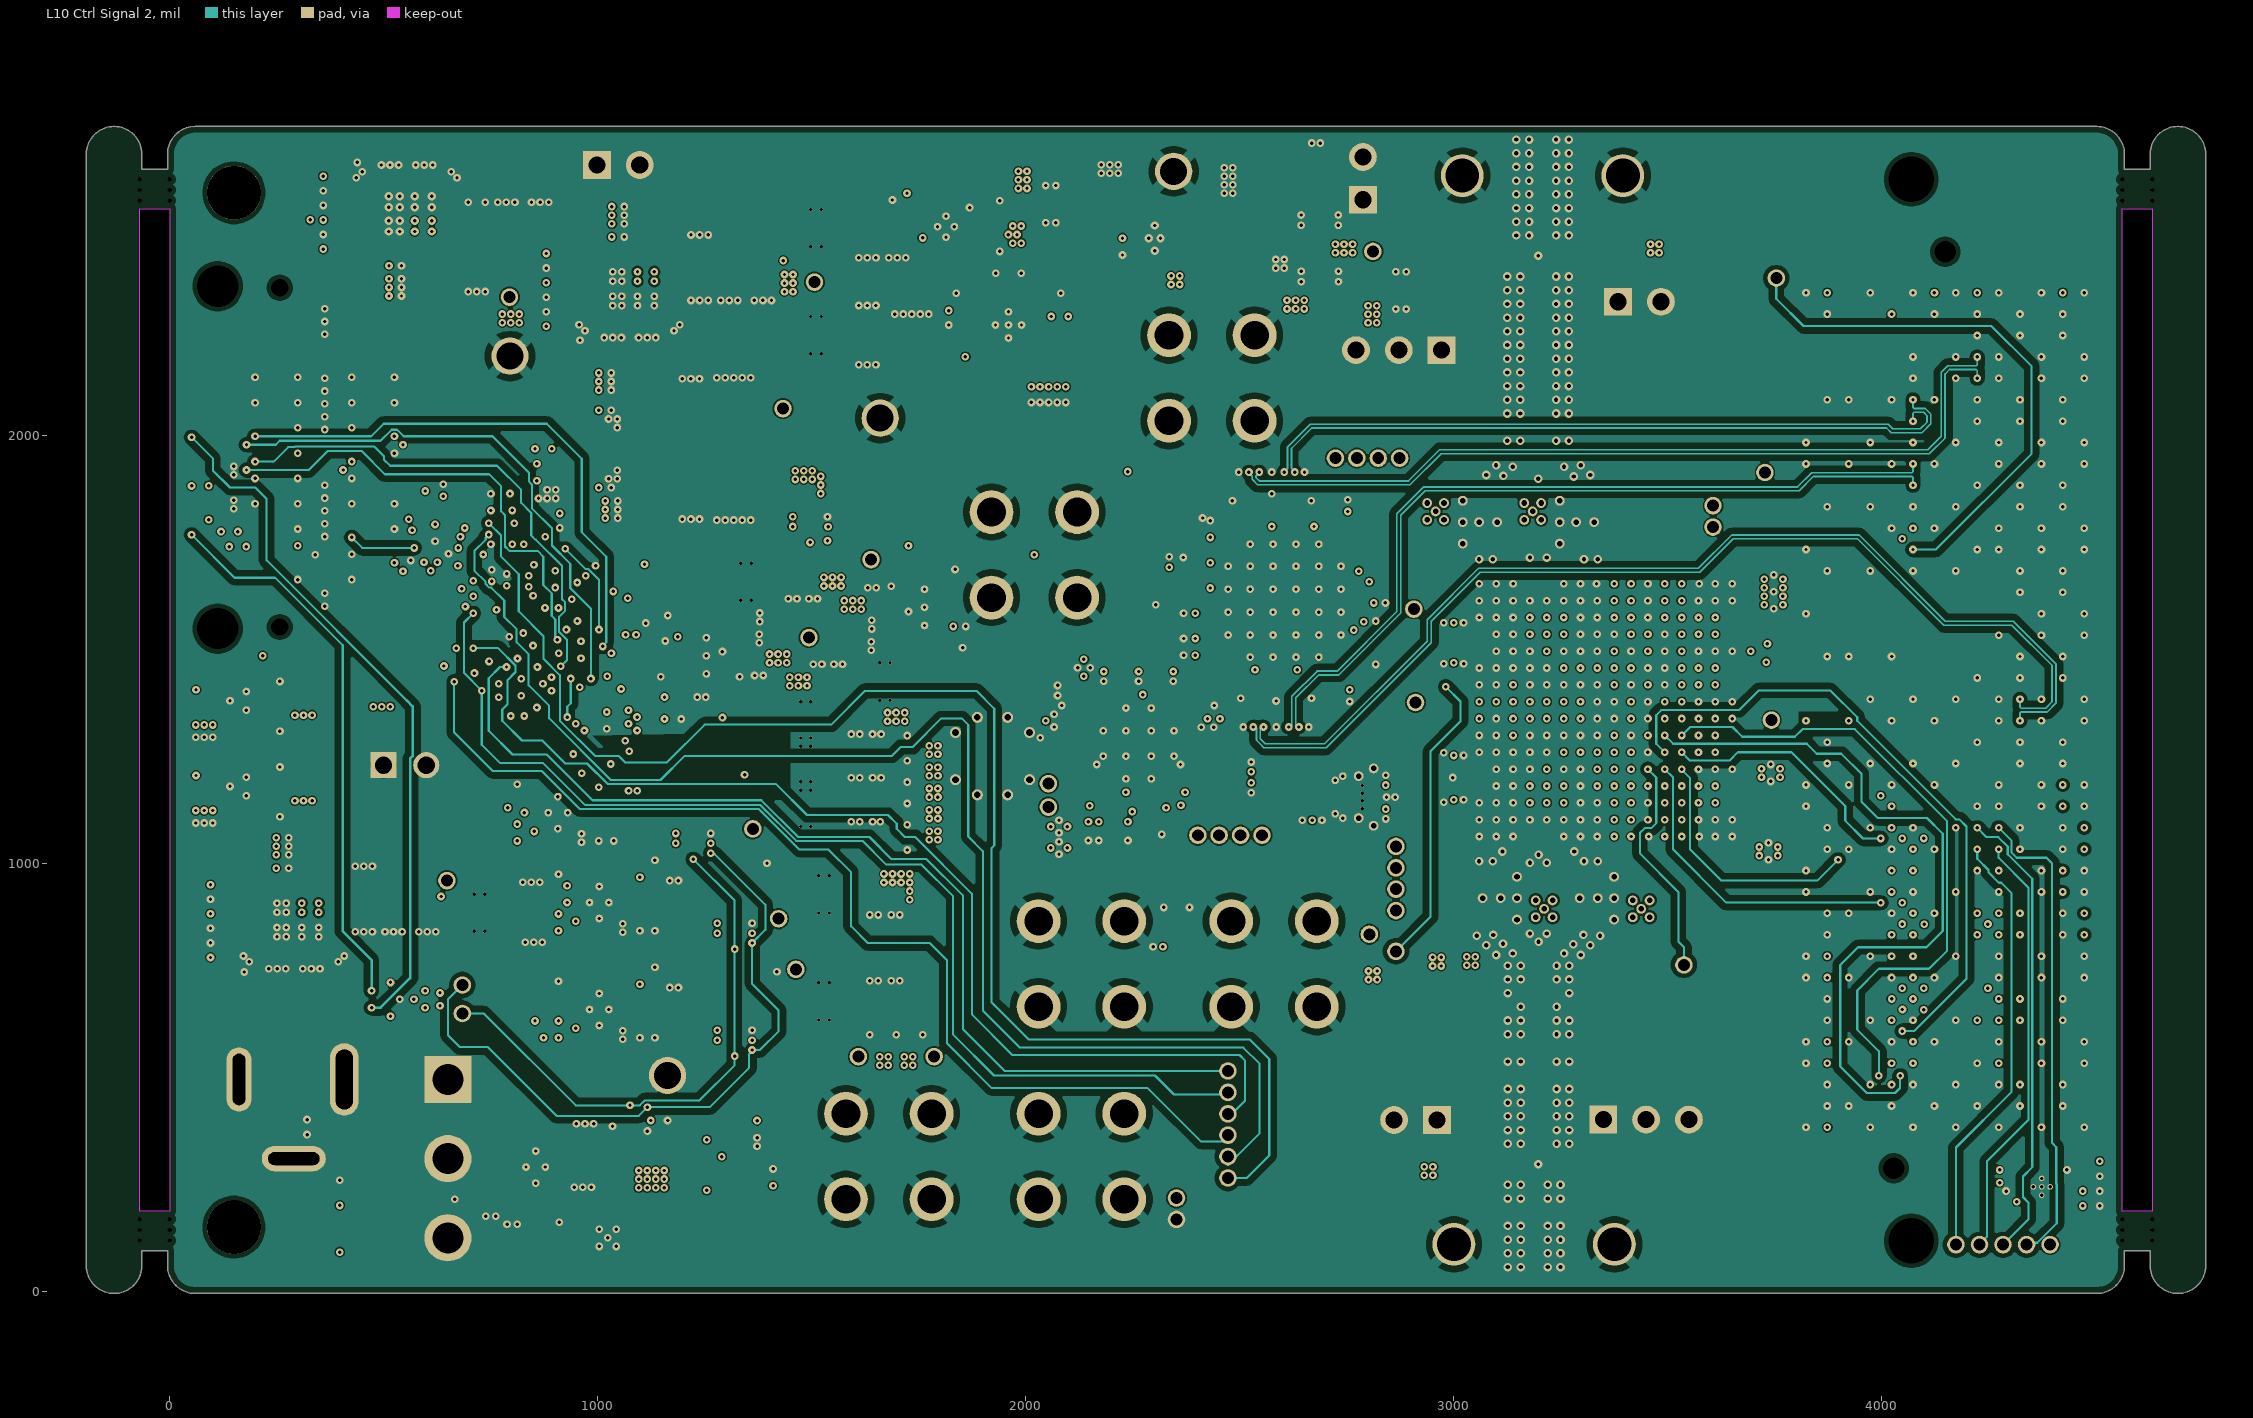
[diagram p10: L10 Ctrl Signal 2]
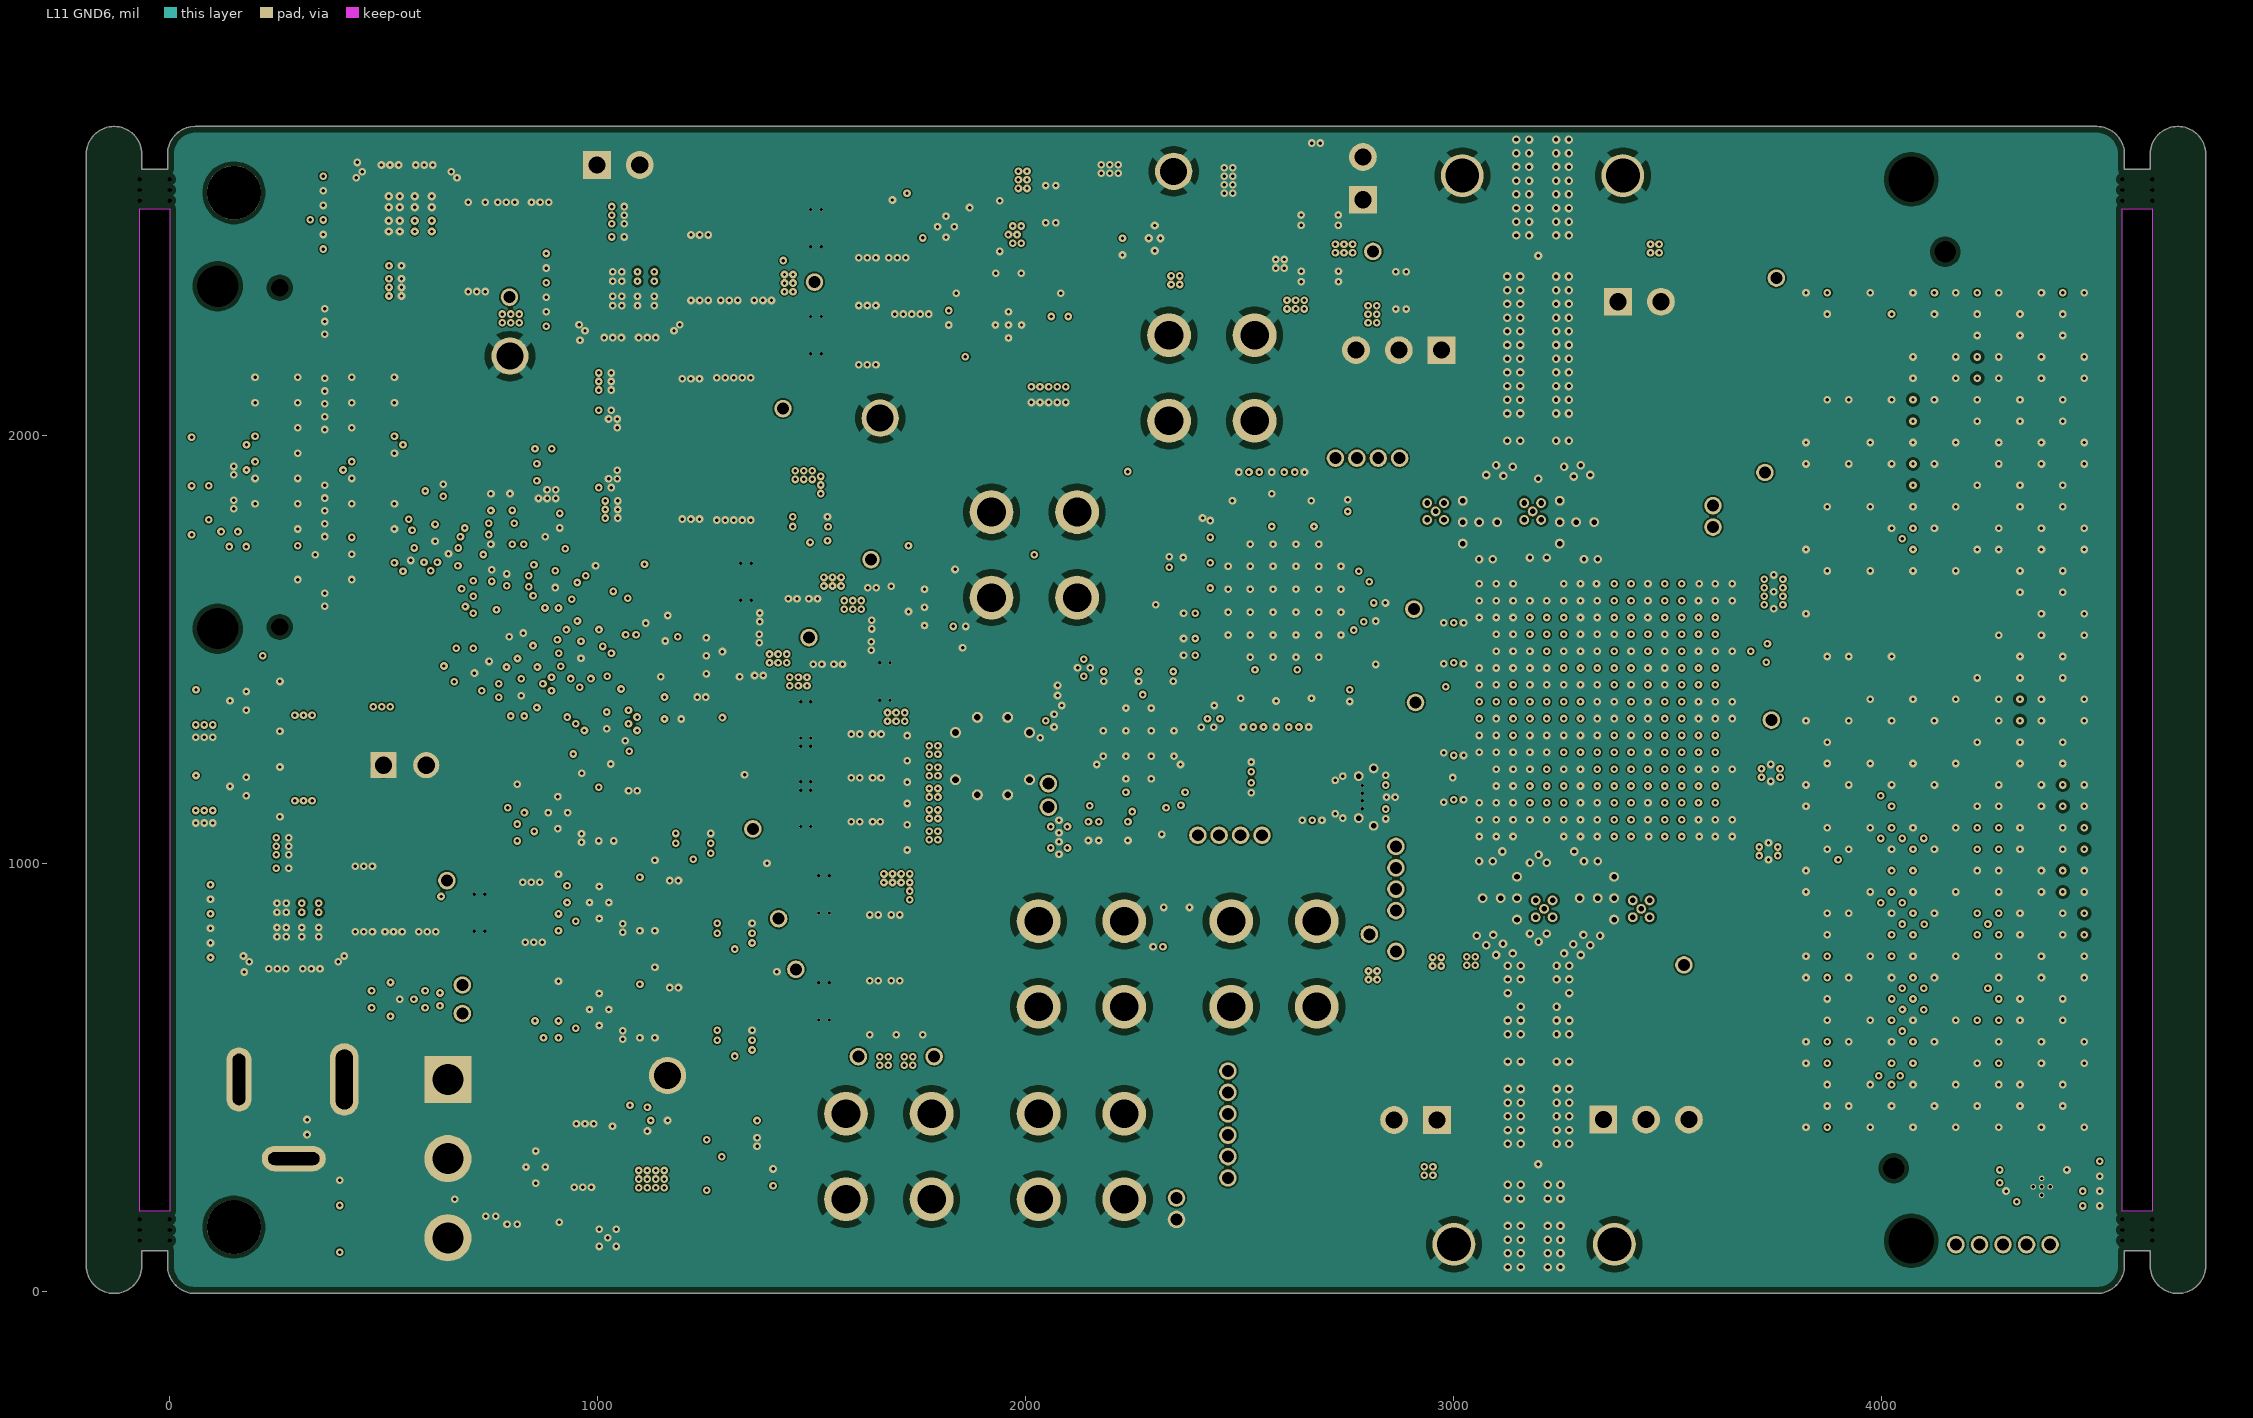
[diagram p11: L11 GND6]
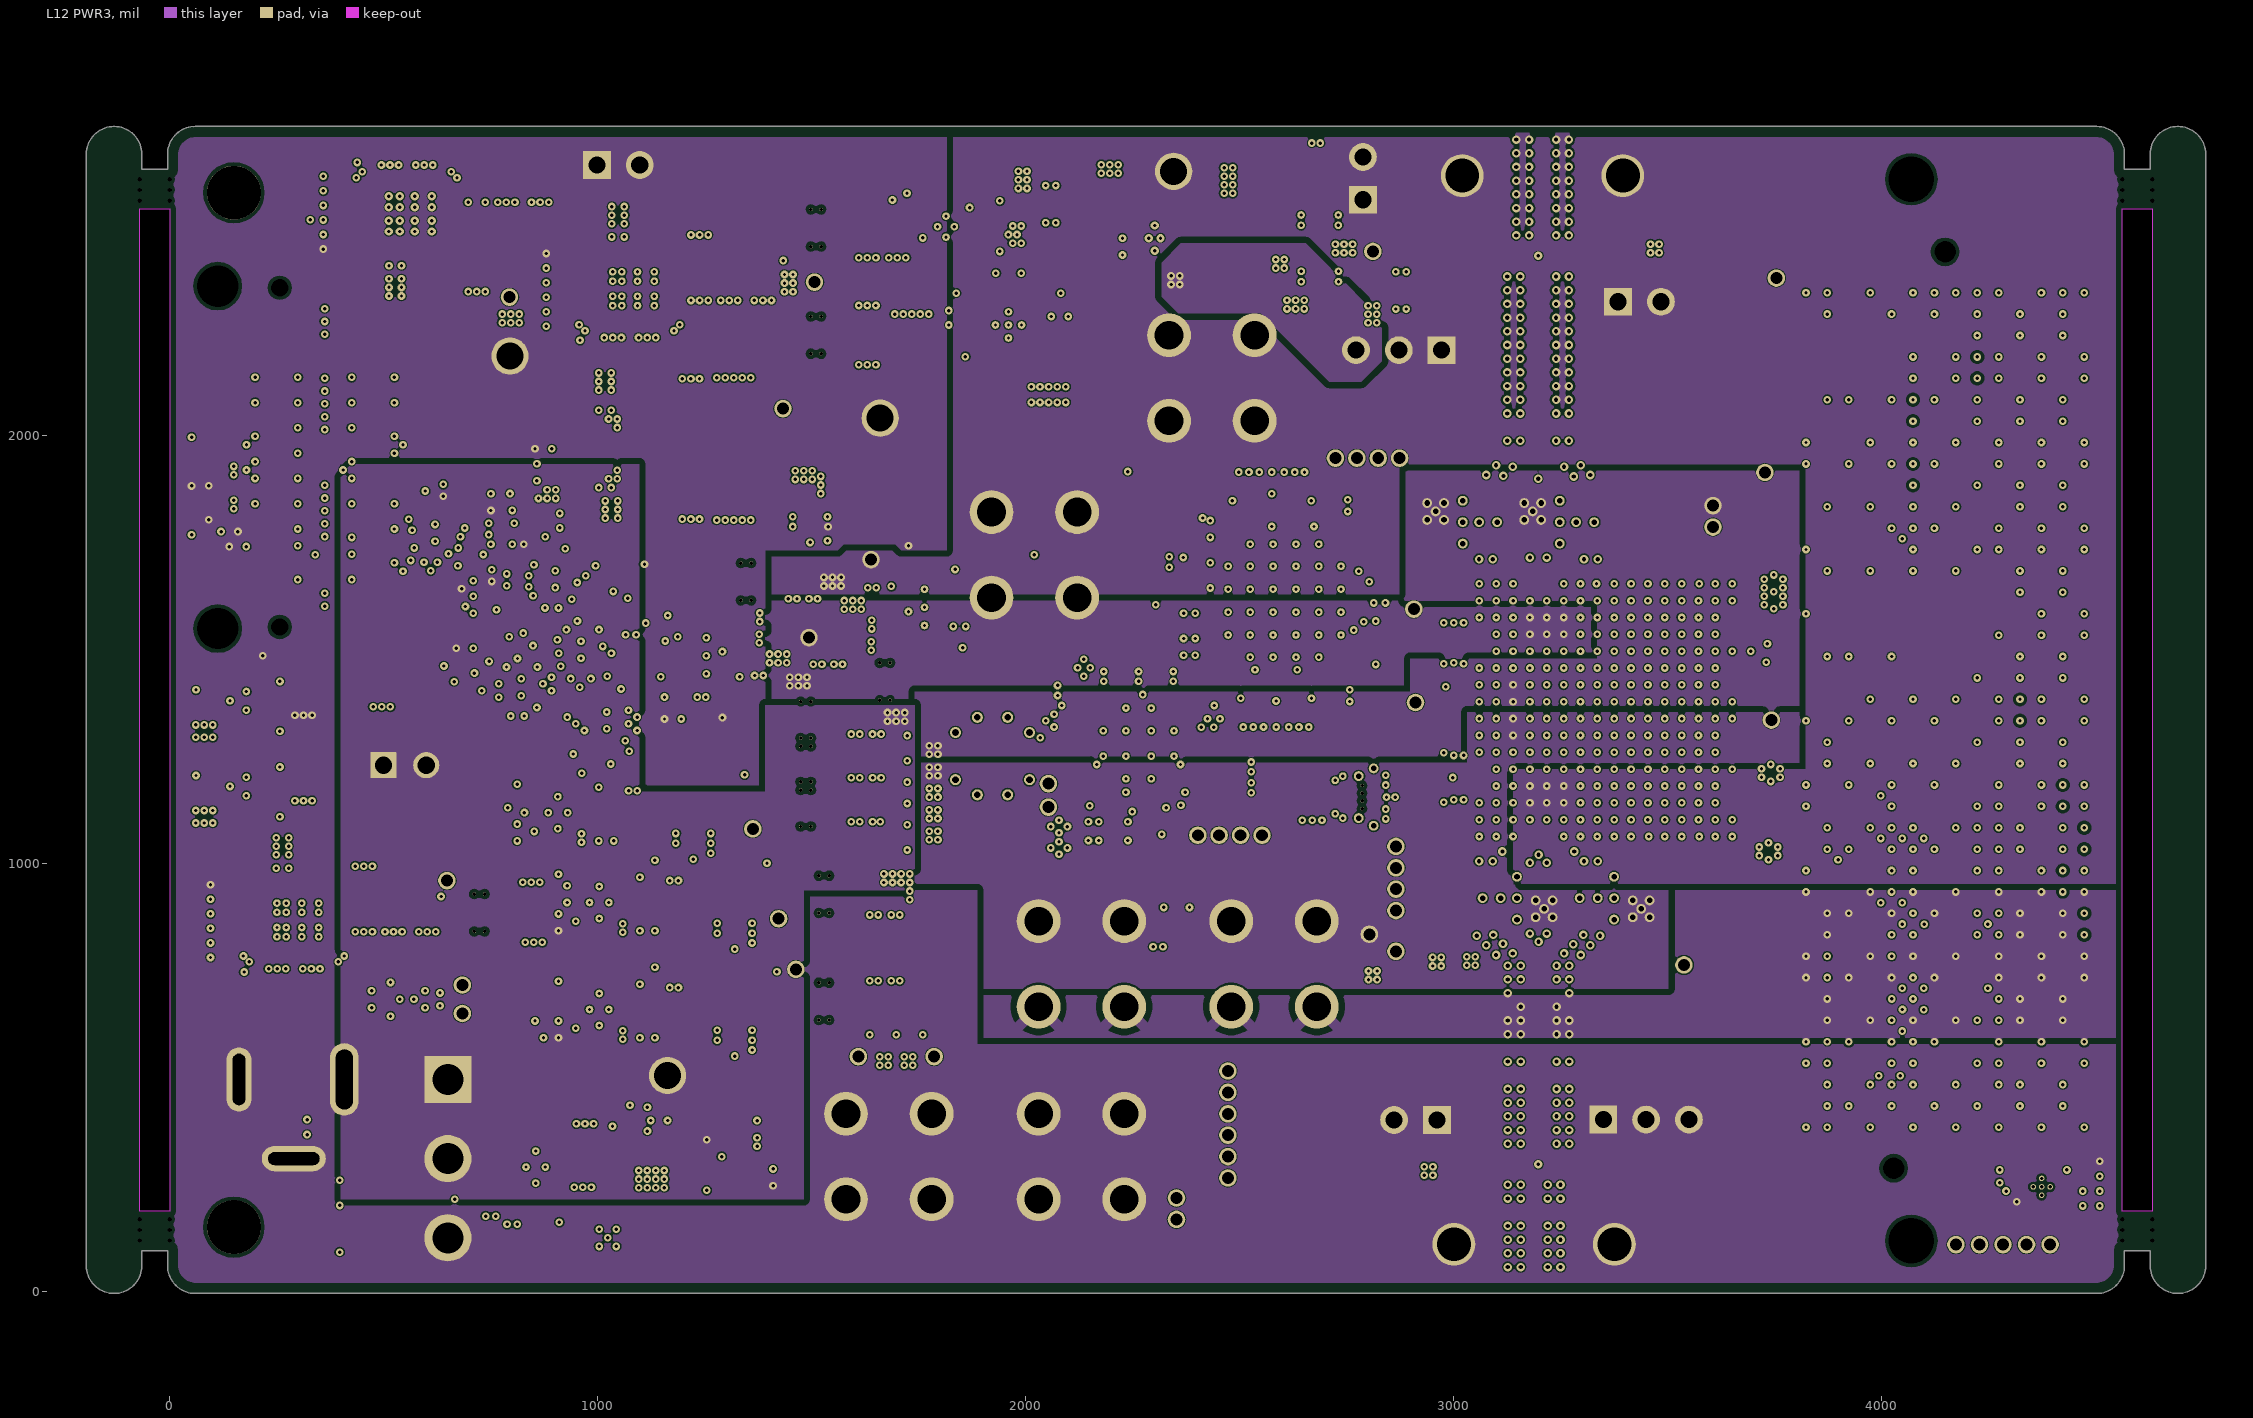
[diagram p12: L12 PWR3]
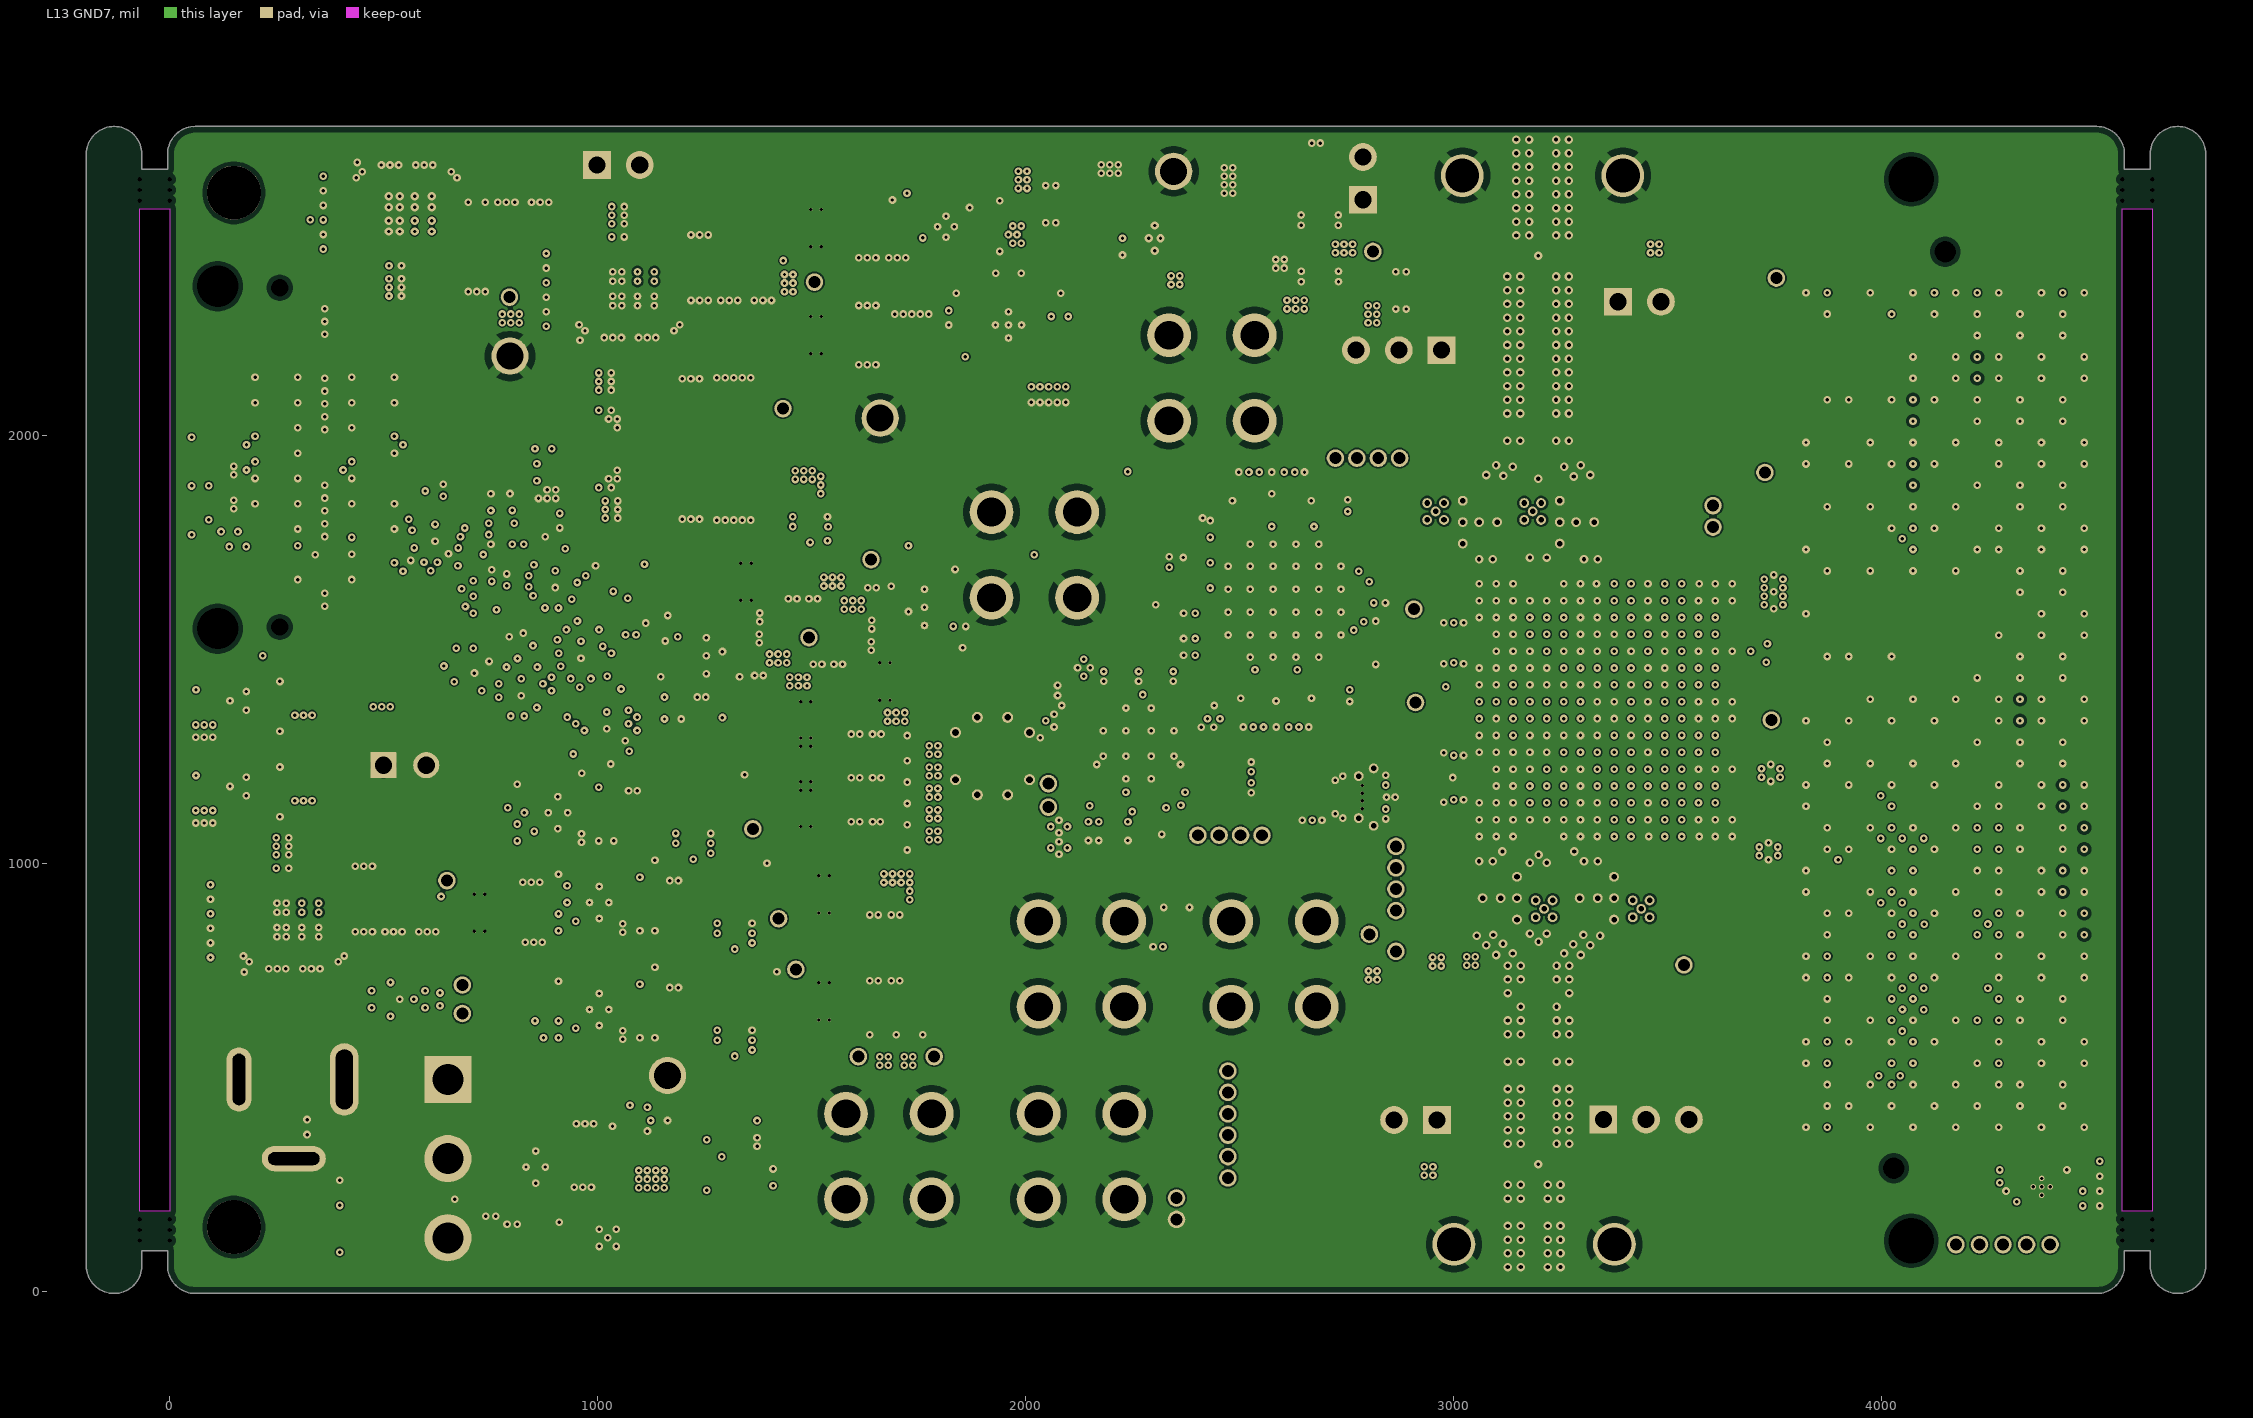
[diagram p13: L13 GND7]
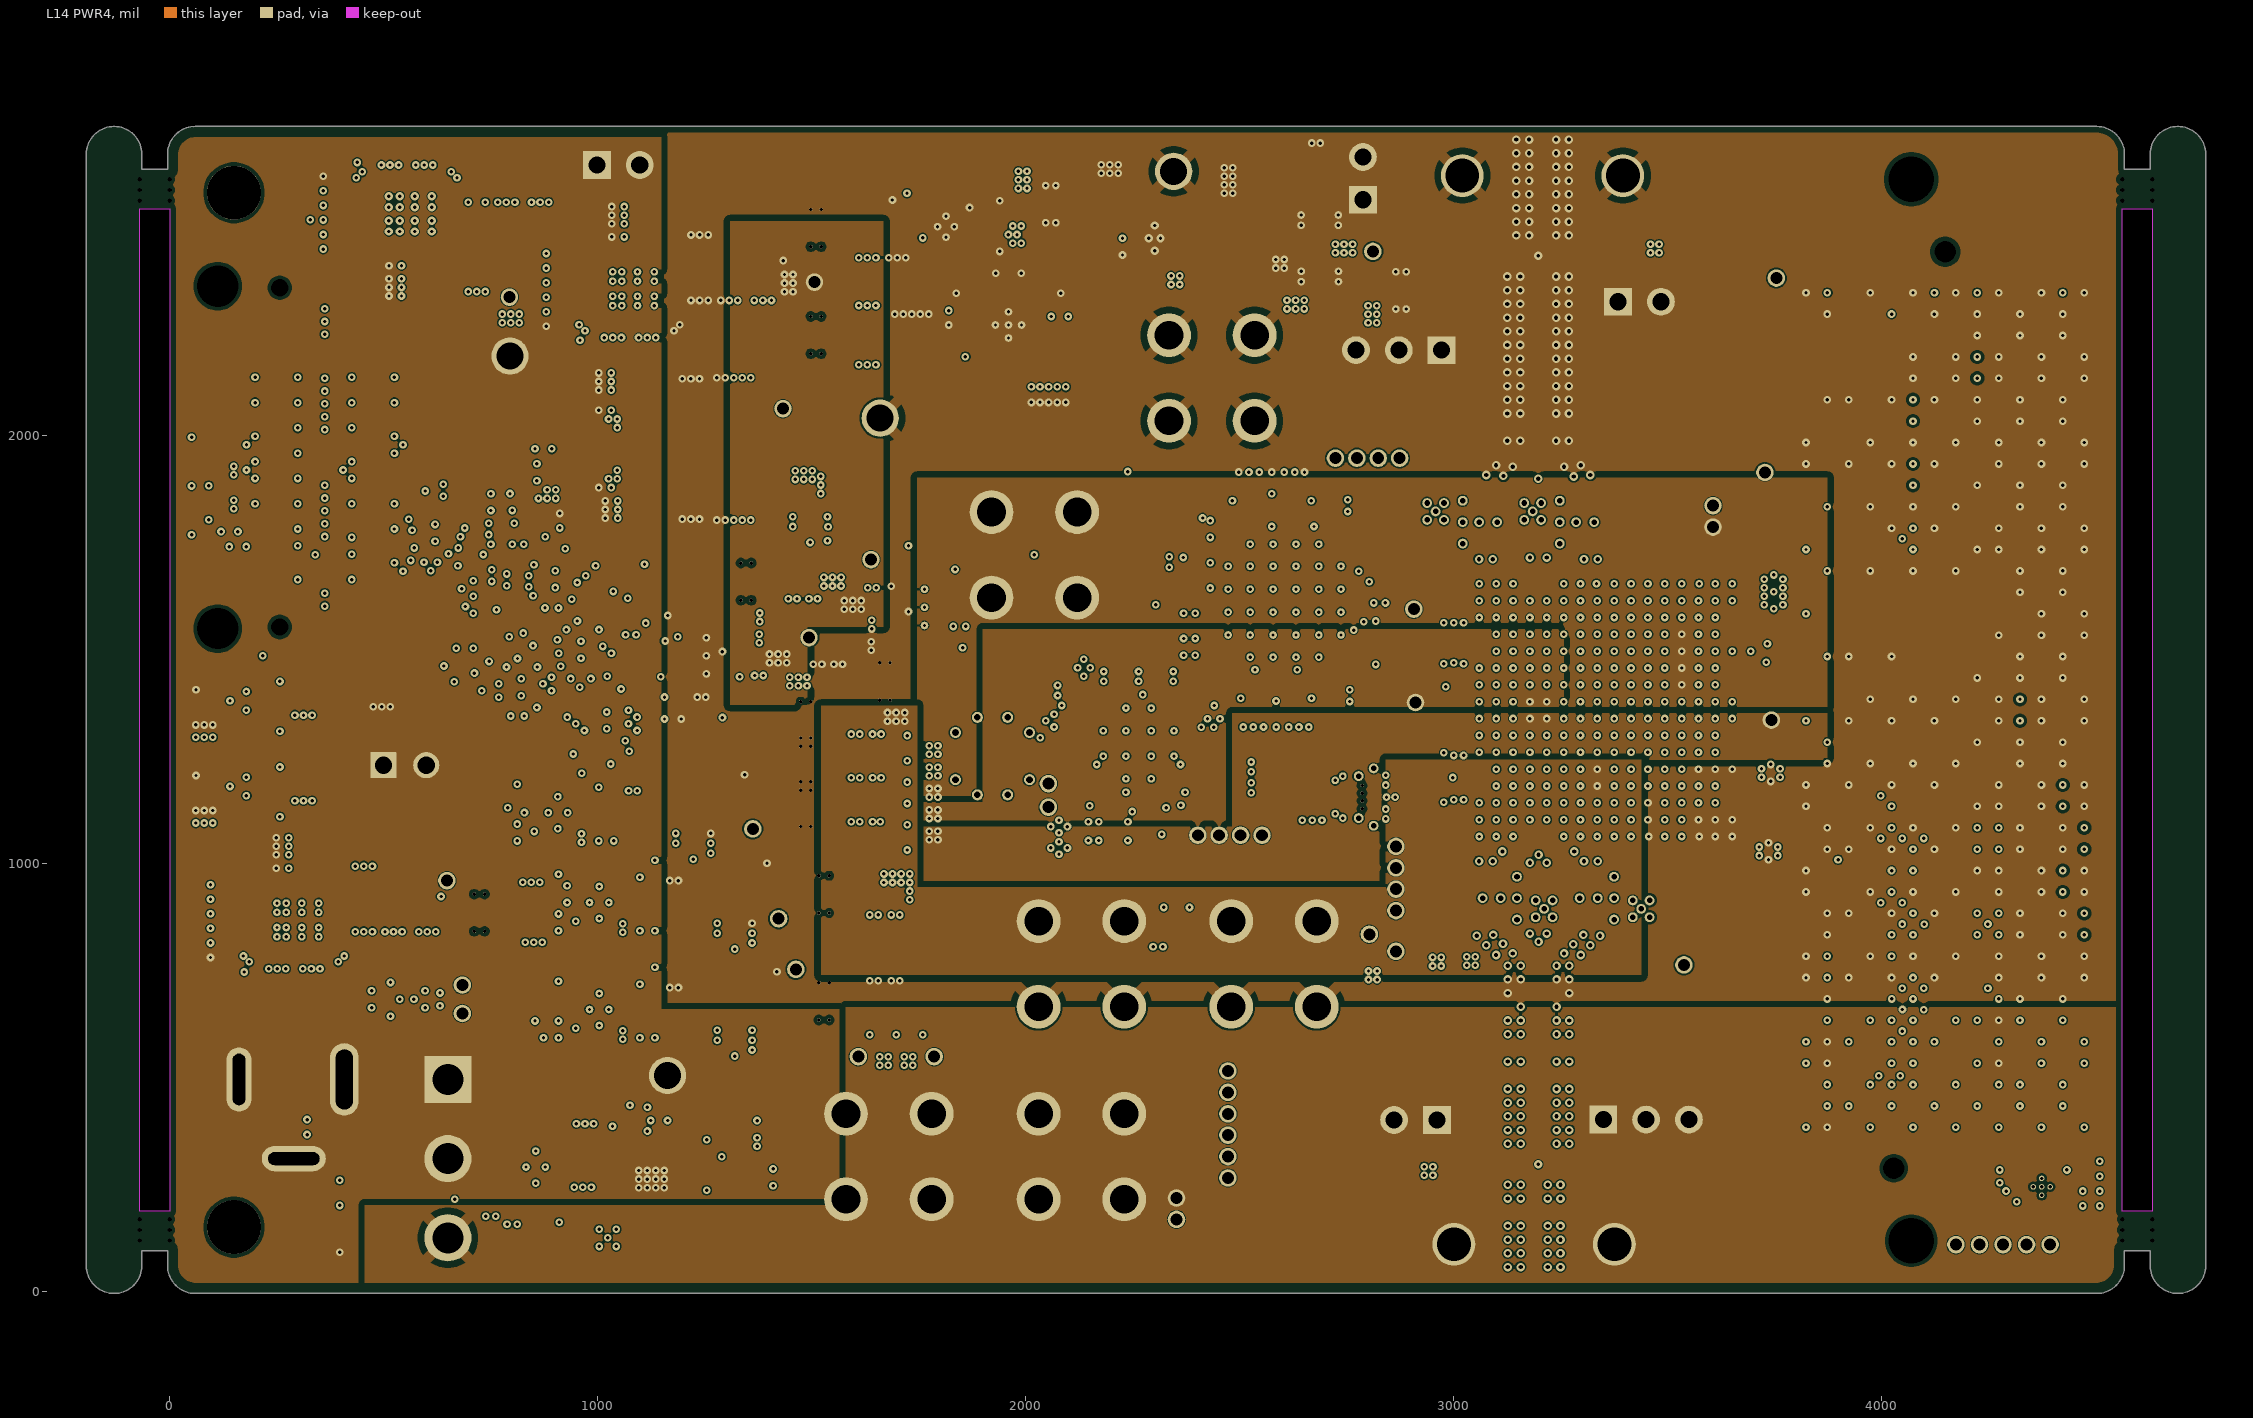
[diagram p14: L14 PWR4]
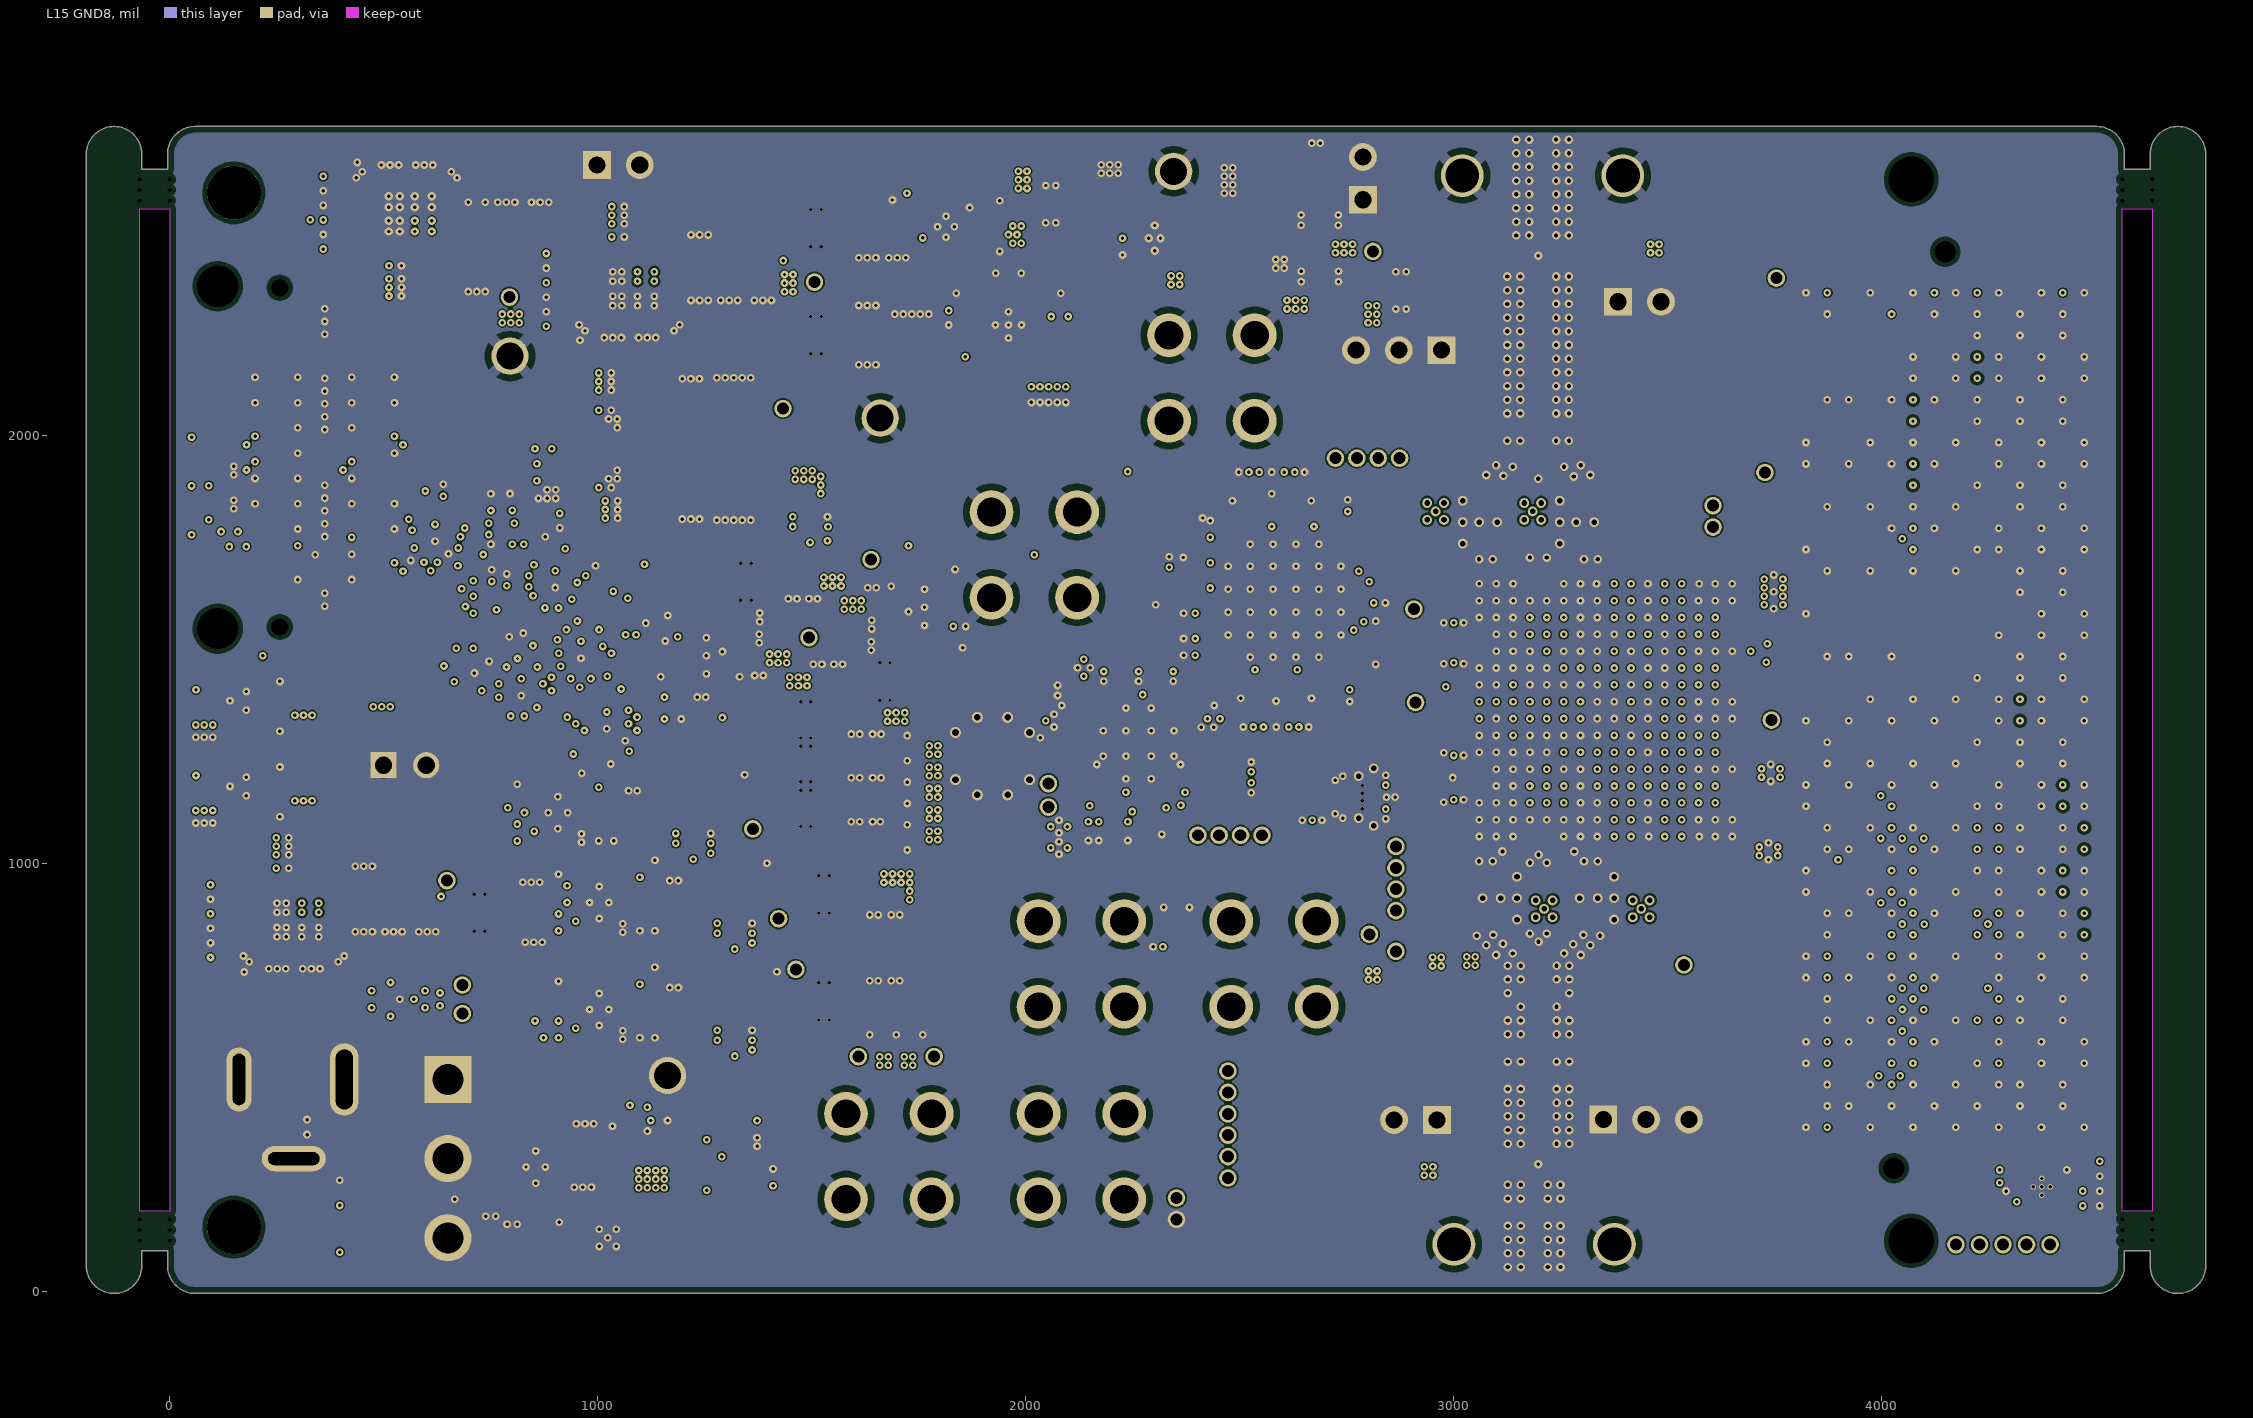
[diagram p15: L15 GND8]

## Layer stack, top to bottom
Top Solder: solder mask 0.4, Solder Resist, Dk 3.5
Top Layer: signal copper 1.4
Dielectric 1: core 4.9, Megtron6, Dk 3.34
L2 GND1: signal copper 1.4
Dielectric 2: prepreg 3, FR4-370HR, Dk 3.72
L3 PWR1: signal copper 1.4
Dielectric 3: prepreg 3, FR4-370HR, Dk 3.72
L4 GND2: signal copper 1.4
Dielectric 4: core 3, FR4-370HR, Dk 3.86
L5 PWR2: signal copper 1.4
Dielectric 5: prepreg 3, FR4-370HR, Dk 3.72
L6 GND3: signal copper 1.4
Dielectric 6: core 3, FR4-370HR, Dk 3.86
L7 Ctrl Signal 1: signal copper 1.4
Dielectric 8: prepreg 3, FR4-370HR, Dk 3.72
Dielectric 7: prepreg 3, FR4-370HR, Dk 3.72
L8 GND4: signal copper 1.4
Dielectric 9: core 6, FR4-370HR, Dk 3.86
L9 GND5: signal copper 1.4
Dielectric 11: prepreg 3, FR4-370HR, Dk 3.72
Dielectric 10: prepreg 3, FR4-370HR, Dk 3.72
L10 Ctrl Signal 2: signal copper 1.4
Dielectric 12: core 3, FR4-370HR, Dk 3.86
L11 GND6: signal copper 1.4
Dielectric 13: prepreg 3, FR4-370HR, Dk 3.72
L12 PWR3: signal copper 1.4
Dielectric 14: core 3, FR4-370HR, Dk 3.86
L13 GND7: signal copper 1.4
Dielectric 15: prepreg 3, FR4-370HR, Dk 3.72
L14 PWR4: signal copper 1.4
Dielectric 16: prepreg 3, FR4-370HR, Dk 3.72
L15 GND8: signal copper 1.4
Dielectric 17: core 4.9, Megtron6, Dk 3.34
Bottom Layer: signal copper 1.4
Bottom Solder: solder mask 0.4, Solder Resist, Dk 3.5

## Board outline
-129.58,-5.01 ccw(c-130,60) -64.99,59.93 -64.98,60 -64.98,94.99 -5.02,94.99 -5.02,60 -5.01,59.93 ccw(c60,60) 60,-5.01 60.06,-5.01 4501.81,-5.01 ccw(c4501.81,60) 4566.83,59.93 4566.83,60 4566.83,94.99 4626.8,94.99 4626.8,60 4626.8,59.93 ccw(c4691.81,60) 4691.39,-5.01 4691.92,-5.01 ccw(c4691.5,60) 4756.52,60 4756.52,2656.54 ccw(c4691.5,2656.54) 4691.92,2721.55 4691.39,2721.55 ccw(c4691.81,2656.54) 4626.8,2656.54 4626.8,2621.55 4566.83,2621.55 4566.83,2656.53 4566.83,2656.61 ccw(c4501.81,2656.53) 4501.88,2721.55 4501.81,2721.55 60.06,2721.55 60,2721.55 ccw(c60,2656.54) -5.02,2656.54 -5.02,2621.55 -64.99,2621.55 -64.99,2656.54 ccw(c-130,2656.54) -129.58,2721.55 -130.11,2721.55 ccw(c-129.69,2656.54) -194.71,2656.54 -194.71,60 ccw(c-129.69,60)
cut-out: -70,2529.73 0,2529.73 0,186.81 -70,186.81
cut-out: 4561.81,2529.73 4631.81,2529.73 4631.81,186.81 4561.81,186.81

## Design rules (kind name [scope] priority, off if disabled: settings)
AcuteAngle [All] p1: minimum=4.50000000000000E+0001 checktracksonly=TRUE
AssemblyTestPointUsage [All] p1: valid=2
BoardOutlineClearance BoardOutlineClearance_EDGE_Connectors [HasFootprint('Johnson_142-0761-881_10p5mil_Launch')] p1: gap=25 ignorepadtopadclearanceinfootprint=FALSE
BoardOutlineClearance BoardOutlineClearance_Poly_GND_Layer2 [OnCopper and IsPoly and InNet('GND') and OnLayer('L2 GND1')] p2: gap=25 ignorepadtopadclearanceinfootprint=FALSE
BoardOutlineClearance BoardOutlineClearance_Poly_GND [OnCopper and IsPoly and InNet('GND')] p3: gap=25 ignorepadtopadclearanceinfootprint=FALSE except(15: Poly-OutlineEdge)
BoardOutlineClearance BoardOutlineClearance_Poly_PWR [OnCopper and IsPoly and NOT InNet('GND')] p4: gap=25 ignorepadtopadclearanceinfootprint=FALSE
BoardOutlineClearance BoardOutlineClearance_MountingHoles_1 [OnCopper and InComponentClass('Mounting Holes')] p5: gap=39.37 ignorepadtopadclearanceinfootprint=FALSE
BoardOutlineClearance BoardOutlineClearance_Poly [OnCopper and IsPoly] p6: gap=25 ignorepadtopadclearanceinfootprint=FALSE
BoardOutlineClearance [OnCopper and Not InComponentClass('Logo') and not InComponentClass('FiducialMark') and not InRegion(1000,500,4000,800) and not InPoly] p7: gap=25 ignorepadtopadclearanceinfootprint=FALSE except(4.8: SMDPad-OutlineEdge THPad-OutlineEdge; 13: Arc-CutoutEdge Track-CutoutEdge SMDPad-CutoutEdge THPad-CutoutEdge Via-CutoutEdge Fill-CutoutEdge Poly-CutoutEdge Region-CutoutEdge Text-CutoutEdge; 20: Via-OutlineEdge; 24: Track-OutlineEdge)
Clearance Clearance_BGA [not InAnyDifferentialPair vs WithinRoom('DAC39RF10') or WithinRoom('FMC')] p1: gap=5 ignorepadtopadclearanceinfootprint=TRUE except(4: Arc-Arc Arc-Track Arc-SMDPad Arc-THPad Arc-Fill Arc-Poly Arc-Region Arc-Text Track-Track Track-SMDPad Track-THPad Track-Fill Track-Poly Track-Region Track-Text; 8: Arc-Hole Track-Hole; 8.1: Arc-Via Track-Via; 10: SMDPad-SMDPad THPad-Fill THPad-Poly THPad-Region)
Clearance Clearance_Poly_GND [InPolygon and InNet('GND')] p2: gap=5 ignorepadtopadclearanceinfootprint=TRUE except(8: Arc-Hole Track-Hole SMDPad-Hole THPad-Hole Via-Hole Fill-Hole Poly-Hole Region-Hole Text-Hole; 10: SMDPad-Fill SMDPad-Poly SMDPad-Region THPad-Fill THPad-Poly THPad-Region; 15: Arc-Fill Arc-Poly Arc-Region Track-Fill Track-Poly Track-Region Fill-Fill Fill-Poly Fill-Region Poly-Poly Poly-Region Region-Region)
Clearance Clearance_Keepouts [((IsTrack Or IsArc) And Not InPoly) And IsFree and IsKeepOut vs ((IsTrack Or IsArc) And Not InPoly) And IsFree and IsKeepOut] p3: gap=0 ignorepadtopadclearanceinfootprint=FALSE
Clearance Clearance_Poly [InPolygon] p4: gap=5 ignorepadtopadclearanceinfootprint=TRUE except(8: Arc-Hole Track-Hole SMDPad-Hole THPad-Hole Via-Hole Fill-Hole Poly-Hole Region-Hole Text-Hole; 15: Fill-Fill Fill-Poly Fill-Region Poly-Poly Poly-Region Region-Region)
Clearance Clearance_FiducialMark [IsKeepOut and InComponentClass('FiducialMark') vs IsPad and InComponentClass('FiducialMark')] p5: gap=0 ignorepadtopadclearanceinfootprint=FALSE
Clearance [All vs not InAnyDifferentialPair] p6: gap=4 ignorepadtopadclearanceinfootprint=TRUE except(5: SMDPad-THPad SMDPad-Via SMDPad-Text THPad-THPad THPad-Via THPad-Text Via-Via Via-Fill Via-Poly Via-Region Via-Text Fill-Fill Fill-Poly Fill-Region Fill-Text Poly-Poly Poly-Region Poly-Text Region-Region Region-Text Text-Text; 7.8: SMDPad-SMDPad; 8: Arc-Hole Track-Hole SMDPad-Hole THPad-Hole Via-Hole Fill-Hole Poly-Hole Region-Hole Text-Hole; 10: THPad-Fill THPad-Poly THPad-Region)
ComponentClearance "ComponentClearance Part Overlap" [(InComponent('C105') OR InComponent('C112'))] p1: gap=0 collisioncheckmode=3 verticalgap=0 showdistances=FALSE
ComponentClearance ComponentClearance_ProbePoints_TH [HasFootprint('ProbePoint_TH_40mil')] p2: gap=10 collisioncheckmode=3 verticalgap=0 showdistances=FALSE donotcheckwithout3dbody=TRUE
ComponentClearance ComponentClearance_THtoSMT_NetTieVias [HasFootprint('Net-Tie-Via-8mil') vs IsSMTComponent] p3: gap=0 collisioncheckmode=3 verticalgap=0 showdistances=FALSE donotcheckwithout3dbody=TRUE
ComponentClearance ComponentClearance_MountingHoles_FiducialMarks [InComponentClass('Mounting Holes') vs InComponentClass('FiducialMark')] p4: gap=50 collisioncheckmode=3 verticalgap=10 showdistances=FALSE
ComponentClearance ComponentClearance_Shunt [InComponentClass('Header') vs InComponentClass('Shunt')] p5: gap=0 collisioncheckmode=3 verticalgap=0 showdistances=FALSE
ComponentClearance ComponentClearance_Logo [InComponentClass('Logo')] p6: gap=50 collisioncheckmode=3 verticalgap=10 showdistances=FALSE
ComponentClearance ComponentClearance_ScrewToNut [(HasFootprint('NY PMS 440 0025 PH')) vs (HasFootprint('Keystone_1902C'))] p7: gap=5 collisioncheckmode=3 verticalgap=10 showdistances=FALSE
ComponentClearance ComponentClearance_MountingHoles [InComponentClass('Mounting Holes')] p8: gap=200 collisioncheckmode=3 verticalgap=100000 showdistances=FALSE
ComponentClearance ComponentClearance_SmallPassives [HasFootprint('0201*') or HasFootprint('0402*') or HasFootprint('0508') or HasFootprint('0603*') or HasFootprint('0612') or HasFootprint('0805*') or HasFootprint('0815*') or HasFootprint('0830*') or HasFootprint('1206*') or HasFootprint('1210*') or HasFootprint('1808*') or HasFootprint('1812*') or HasFootprint('1825*') or HasFootprint('2010*') or HasFootprint('2220*') or HasFootprint('2225*') or HasFootprint('2512*') or HasFootprint('2728*') or HasFootprint('3518*') vs HasFootprint('0201*') or HasFootprint('0402*') or HasFootprint('0508') or HasFootprint('0603*') or HasFootprint('0612') or HasFootprint('0805*') or HasFootprint('0815*') or HasFootprint('0830*') or HasFootprint('1206*') or HasFootprint('1210*') or HasFootprint('1808*') or HasFootprint('1812*') or HasFootprint('1825*') or HasFootprint('2010*') or HasFootprint('2220*') or HasFootprint('2225*') or HasFootprint('2512*') or HasFootprint('2728*') or HasFootprint('3518*')] p9: gap=7 collisioncheckmode=3 verticalgap=7 showdistances=FALSE
ComponentClearance ComponentClearance_THtoSMT [IsThruComponent vs IsSMTComponent] p10: gap=20 collisioncheckmode=3 verticalgap=0 showdistances=FALSE
ComponentClearance ComponentClearance_THtoTH [IsThruComponent vs IsThruComponent] p11: gap=30 collisioncheckmode=3 verticalgap=30 showdistances=FALSE
ComponentClearance [All] p12: gap=7 collisioncheckmode=3 verticalgap=7 showdistances=FALSE
DiffPairsRouting [InDifferentialPairClass('All Differential Pairs')] p1: maxlimit=15 minlimit=3 mostfreqgap=4 toplayer_prefgap=3.5 toplayer_minwidth=3 toplayer_maxwidth=15 toplayer_prefwidth=6.25 midlayer1_minwidth=3 midlayer1_maxwidth=15 midlayer1_prefwidth=5 midlayer2_minwidth=3 midlayer2_maxwidth=15 midlayer2_prefwidth=5 midlayer3_minwidth=3 midlayer3_maxwidth=15 midlayer3_prefwidth=5 midlayer4_minwidth=3 midlayer4_maxwidth=15 midlayer4_prefwidth=5 midlayer5_minwidth=3 midlayer5_maxwidth=15 midlayer5_prefwidth=5 midlayer6_minwidth=3 midlayer6_maxwidth=15 midlayer6_prefwidth=5 midlayer7_minwidth=3 midlayer7_maxwidth=15 midlayer7_prefwidth=5 midlayer8_minwidth=3 midlayer8_maxwidth=15 midlayer8_prefwidth=5 midlayer9_minwidth=3 midlayer9_maxwidth=15 midlayer9_prefwidth=5 midlayer10_minwidth=3 midlayer10_maxwidth=15 midlayer10_prefwidth=5 midlayer11_prefgap=5 midlayer11_minwidth=3 midlayer11_maxwidth=15 midlayer11_prefwidth=4 midlayer12_prefgap=5 midlayer12_minwidth=3 midlayer12_maxwidth=15 midlayer12_prefwidth=4 midlayer13_minwidth=3 midlayer13_maxwidth=15 midlayer13_prefwidth=5 midlayer14_minwidth=3 midlayer14_maxwidth=15 midlayer14_prefwidth=5 bottomlayer_prefgap=3.5 bottomlayer_minwidth=3 bottomlayer_maxwidth=15 bottomlayer_prefwidth=6.25 maxuncoupledlength=1000
FabricationTestPointUsage TestPointUsage [All] p1: valid=2 allowmultiple=FALSE
FabricationTestpoint Testpoint [All] p1: side=3 testpointundercomponent=TRUE minsize=40 maxsize=100 preferedsize=60 minholesize=0 maxholesize=40 preferedholesize=32 testpointgrid=1 allowsidetop=TRUE allowsidebottom=TRUE usegrid=TRUE gridtolerance=0.01
FanoutControl Fanout_LCC [IsLCC] p1: bgadir=Out bgaviamode=Centered fanoutstyle=Auto fanoutdirection=Alternating viagrid=1 // Fanout_LCC (Default Rule)
FanoutControl Fanout_BGA [IsBGA] p2: bgadir=Out bgaviamode=Centered fanoutstyle=Auto fanoutdirection=Alternating viagrid=1 // Fanout_BGA (Default Rule)
FanoutControl Fanout_Default [All] p4: bgadir=Out bgaviamode=Centered fanoutstyle=Auto fanoutdirection=Alternating viagrid=1 // Fanout_Default (Default Rule)
FanoutControl Fanout_Small [(CompPinCount < 5)] p5: bgadir=Out bgaviamode=Centered fanoutstyle=Auto fanoutdirection=OutThenIn viagrid=1 // Fanout_Small (Default Rule)
HoleSize [All] p1: absolutevalues=TRUE maxlimit=251 minlimit=7.87 maxpercent=80.000 minpercent=20.000
HoleToHoleClearance HoleToHoleClearance_MarkiBalun [(InComponent('t4') OR InComponent('t5'))] p1: gap=7 allowstackedmicrovias=TRUE
HoleToHoleClearance [All] p2: gap=8 allowstackedmicrovias=TRUE
Length DAC_SYSREF [InNet('NetC296_2') or InNet('NetC298_2')] p1: maxlimit=1135 minlimit=1133
Length "Clk LMX to Switch" [InNet('CLK_n') or InNet('CLK_p')] p2: maxlimit=912 minlimit=911
MinimumAnnularRing MinimumAnnularRing_ThermalPadVias [IsVia and InAnyComponent] p1: minimumring=0
MinimumAnnularRing [All] p2: minimumring=0
MinimumSolderMaskSliver MinimumSolderMaskSliver_copper [InPadClass('All Pads')] p1: minsoldermaskwidth=3
MinimumSolderMaskSliver MinimumSolderMaskSliver_Baluns [InComponent('T4')or InComponent('T5')] p2: minsoldermaskwidth=0
MinimumSolderMaskSliver MinimumSolderMaskSliver_Logo [InComponentClass('Logo') vs InComponentClass('Logo')] p3: minsoldermaskwidth=0.7
MinimumSolderMaskSliver [All] p4: minsoldermaskwidth=3
NetAntennae [Not((InNetClass('PWR1') or InNetClass('PWR2') or InNetClass('PWR3') or InNetClass('PWR4')) and ViaDiameter = 20)] p1: netantennaetolerance=0
PlaneConnect [All] p1: planeconnectstyle=Relief reliefexpansion=10 reliefentries=4 reliefconductorwidth=10 reliefairgap=10
PolygonConnect "Thermal Pads" [IsPolygon vs IsPad and HoleSize <= 41] p1: connectstyle=Direct reliefconductorwidth=10 reliefentries=4 polygonreliefangle="90 Angle" airgapwidth=10
PolygonConnect [All] p2: thpad.connectstyle=Relief thpad.reliefconductorwidth=25 thpad.reliefentries=4 thpad.polygonreliefangle="45 Angle" thpad.airgapwidth=15 smdpad.connectstyle=Direct smdpad.reliefconductorwidth=10 smdpad.reliefentries=4 smdpad.polygonreliefangle="90 Angle" smdpad.airgapwidth=10 via.connectstyle=Direct via.reliefconductorwidth=10 via.reliefentries=4 via.polygonreliefangle="90 Angle" via.airgapwidth=10
RoutingVias ThermalPadVias [IsVia and InAnyComponent] p1: holewidth=7.87 width=19.68 viastyle="Through Hole" minholewidth=6 minwidth=16 maxholewidth=65 maxwidth=65
RoutingVias [All] p2: holewidth=16 width=34 viastyle="Through Hole" minholewidth=6 minwidth=16 maxholewidth=40 maxwidth=65
SilkToBoardRegionClearance [Not ((IsComment or IsDesignator) And (Hide <> 'False')) and not InRegion(1000,500,4000,800)] p1:
SilkToSilkClearance SilkToSilkClearance_Pb-FreeLogo [(HasFootprint('Pb-Free_Overlay_Medium') OR HasFootprint('Pb-Free_Overlay_Small')) vs (HasFootprint('Pb-Free_Overlay_Medium') OR HasFootprint('Pb-Free_Overlay_Small'))] p1: silktosilkclearance=1
SilkToSilkClearance [All] p2: silktosilkclearance=1
SilkToSolderMaskClearance SilkToComponentPadClearance [(IsPad or IsFill or IsRegion) and InAnycomponent] p1: minsilkscreentomaskgap=1 clearancetoexposedcopper=TRUE
SilkToSolderMaskClearance "Silk to Solder Mask Opening" [All] p2: minsilkscreentomaskgap=1 clearancetoexposedcopper=FALSE
SolderMaskExpansion [All] p1: expansion=1.5 istentingtop=FALSE
UnRoutedNet [All] p1: checkbadconnections=TRUE
Width Width_InPolygon [InNet('GND') OR InNet('3p3V') OR InNet('1p8V') OR InNet('LMX_2p5V')] p1: maxlimit=10000 minlimit=0 preferedwidth=0 checkconnectedcopper=TRUE
Width [All] p2: maxlimit=100 minlimit=4 preferedwidth=5 checkconnectedcopper=TRUE
12 further rules are at their usual default settings.

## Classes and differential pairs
component class Header: J13 J17
component class "TRF1108 RevA": C189 C263 C265 C266 C267 C268 C269 C270 C271 C272 C273 C275 C276 C278 C279 C280 C281 C282 C283 C286 FB8 FB9 J13 J14 J15 J17 J18 J19 L3 L4 L5 L6 L7 L8 L9 L10 R186 R187 R192 R196 R197 R200 R201 R202 R236 R237 R242 R246 R247 R250 R251 R252 R255 R256 SH-J13 SH-J14 SH-J17 SH-J18 T2 T3 T4 T5 U41 U42
net class LMX_Clocks: DAC_CLK_n DAC_CLK_p GND LMX_CLKOUT0_n LMX_CLKOUT0_p LMX_DAC_SYSREF_n LMX_DAC_SYSREF_p LMX_LOGIC_CLK_n LMX_LOGIC_CLK_p LMX_LOGIC_SYSREF_n LMX_LOGIC_SYSREF_p LMX_LOGICCLK_n LMX_LOGICCLK_p LMX_LOGICSYSREFOUT0_n LMX_LOGICSYSREFOUT0_p LMX_SYSREFOUT0_n LMX_SYSREFOUT0_p NetC143_2 NetC144_2 NetC151_1 NetC151_2 NetC152_1 NetC152_2 NetPP17_1 NetPP18_1 NetR123_1 NetR123_2 VCCLOGIC
net class LMK_Clocks: DAC_SYSREF_n DAC_SYSREF_p DCLKOUT2_n DCLKOUT2_p DCLKOUT4_n DCLKOUT4_p DCLKOUT6_n DCLKOUT6_p FPGA_CORECLK_n FPGA_CORECLK_p FPGA_SYSREF_n FPGA_SYSREF_p GBTCLK0_FMC_n GBTCLK0_FMC_p GBTCLK1_FMC_n GBTCLK1_FMC_p LMK_CLKIN0_n LMK_CLKIN0_p LMK_CLKIN1_n LMK_CLKIN1_p SDCLKOUT1_n SDCLKOUT1_p SDCLKOUT3_n SDCLKOUT3_p
net class LMXK: 2p5V_Clock 3p3V_Clock
net class I2C: FMC_I2C_SCL FMC_I2C_SDA SCL_I2C SDA_I2C USB_I2C_SCL USB_I2C_SDA
component class "DC-DC DAC Digital RevA": C28 C29 C30 C31 C32 C33 C34 C35 C36 C37 C38 L1 PP2 R34 R35 R36 R37 R38 R39 R40 R41 R42 R43 R44 R45 R46 R47 U9 U10
component class "DAC39RF10 IO RevA": C171 C172 C173 PP39 PP40 PP41 R170 R171 R172 R173 R174 R175 R176 R177 SW2 U37
component class "USB FTDI Comms RevA": J6 R111 R112 R113 R114 R115 R116 U22 U23
component class "Hardware RevA": !PCB FanNotes1 FH1 FID1 FID2 FID3 fid4 fid5 fid6 H1 H2 H3 H4 H5 H6 H7 H8 LBL1 Logo1 LOGO2 Logo3 LOGO4 Logo5 LOGO6 Logo7 MP1 MP5 ZZ1 ZZ2 ZZ3 ZZ4
component class "FMC+ Sections J - Z RevA": J1 R231 R232 R233 R234
component class "FMC+ Sections A-H RevA": C262 PP42 PP43 PP44 PP45 PP46 PP47 PP48 PP49 R204 R205 R206 R207 R208 R209 R210 R211 R212 R213 R214 R215 R216 R217 R218 R219 R220 R221 R222 R223 R224 R225 R226 R227 R228 R229 R230 U38
component class "DC-DC LMX LMK Clocking RevA": C11 C12 C13 C14 C15 C16 C17 C18 C19 C20 C21 C22 C23 C24 C25 C26 C27 FB1 FC1 FC2 PP1 R15 R16 R17 R18 R19 R20 R21 R22 R23 R24 R25 R26 R27 R28 R29 R30 R31 R32 R33 U6 U7 U8
component class "DC-DC Analog RevA": C39 C40 C41 C42 C43 C44 C45 C46 C47 FB2 FC3 PP3 R48 R49 R50 R51 R52 R53 U11
component class "DAC LDO N1p8V RevA": C96 C97 C98 C99 C100 C101 C102 C103 C104 C105 C106 C107 C108 C109 C110 C111 C112 FC7 FC8 PP11 PP12 R84 R85 R86 R87 R88 R89 R90 R91 R92 U15 U16 U17
component class "DAC LDO 1p8V RevA": C48 C49 C50 C51 C52 C53 C54 C55 C56 C57 C58 C59 C60 C61 C62 C63 FB3 FC4 FC5 FC6 PP4 PP5 PP6 PP7 PP8 PP9 R54 R55 R56 R57 R58 R59 R60 R61 U12 U13
component class "DAC LDO 1p0V RevA": C113 C114 C115 C116 C117 C118 C119 C120 C121 C122 C123 C124 C125 C126 C127 C128 FB4 FB5 FC9 FC10 PP13 PP14 PP15 PP16 R93 R94 R95 R96 R97 R98 R99 R100 R101 R102 R103 R104 R105 R106 R107 R108 R109 R110 U18 U19 U20 U21
component class "DAC39RF10 Power RevA": C190 C191 C192 C193 C194 C195 C196 C197 C198 C199 C200 C201 C202 C203 C204 C205 C206 C207 C208 C209 C210 C211 C212 C213 C214 C215 C216 C217 C218 C219 C220 C221 C222 C223 C224 C225 C226 C227 C228 C229 C230 C231 C232 C233 C234 C235 C236 C237 C238 C239 C240 C241 C242 C243 C244 C245 C246 C247 C248 C249 C250 C251 C252 C253 C254 C255 C256 C257 C258 C259 C260 C261 U1
component class "Power TRF1108 RevA": C174 C175 C176 C177 C178 C179 C180 C181 C182 C183 C184 C185 C186 C187 C188 C264 C274 FB6 FB7 FB10 FC11 FC12 FC13 FC14 J16 PP50 PP51 R178 R179 R180 R181 R182 R183 R184 R185 R189 U39 U40
component class "Comms I2C LMX LMK Mux RevA": C161 C162 C163 C164 C165 C166 C167 J12 PP23 PP24 PP25 PP26 PP27 PP28 PP29 PP30 PP31 PP32 PP33 R148 R149 R150 R151 R152 R153 R154 R155 R156 R157 R158 R159 R160 R161 R162 U27 U28 U29 U30 U31 U32 U33
component class "Comms Mux DAC RevA": C168 C169 C170 PP34 PP35 PP36 PP37 PP38 R163 R164 R165 R166 R167 R168 R169 U34 U35 U36
component class "Clocking LMX1204 RevA": C129 C130 C131 C132 C133 C134 C135 C136 C137 C138 C139 C140 C141 C142 C143 C144 C145 C146 C147 C148 C149 C150 C151 C152 C153 C154 C155 C156 C157 C158 C159 C160 J7 J8 J9 J10 J11 PP17 PP18 PP19 PP20 PP21 PP22 R117 R118 R119 R120 R121 R122 R123 R124 R125 R126 R127 R128 R129 R130 R131 R132 R133 R134 R135 R136 R137 R138 R139 R140 R141 R142 R143 R144 R145 R146 R147 T1 U24 U25 U26
component class "Clocking LMK04828 RevA": C64 C65 C66 C67 C68 C69 C70 C71 C72 C73 C74 C75 C76 C77 C78 C79 C80 C81 C82 C83 C84 C85 C86 C87 C88 C89 C90 C91 C92 C93 C94 C95 J4 J5 PP10 R62 R63 R64 R65 R66 R67 R68 R69 R70 R71 R72 R73 R74 R75 R76 R77 R78 R79 R80 R81 R82 R83 U14
component class "12V Input RevA": C1 C2 C3 C4 C5 C6 C7 C8 C9 C10 D1 D2 D3 F1 J2 J3 Q1 R1 R2 R3 R4 R5 R6 R7 R8 R9 R10 R11 R12 R13 R14 SW1 TP1 TP2 TP3 TP4 U2 U3 U4 U5
net class GenPwr: 3p3V_Utility 5V_Utility 12V 12V_FMC
net class PWR4: VDDIO VDDR VDDSYS18
net class PWR3: VDDA18A VDDA18B VDDCLK18 VEExA VEExB
net class PWR2: VDDCLK10 VDDLA VDDLB
net class PWR1: DVDD
net class Power: 2p5V_Clock 3p3V_Clock 3p3V_Utility 5V_Utility 12V 12V_FMC DVDD VDDA18A VDDA18B VDDCLK10 VDDCLK18 VDDIO VDDLA VDDLB VDDR VDDSYS18 VEExA VEExB
net class serdes: 0SRX_n 0SRX_p 1SRX_n 1SRX_p 2SRX_n 2SRX_p 3SRX_n 3SRX_p 4SRX_n 4SRX_p 5SRX_n 5SRX_p 6SRX_n 6SRX_p 7SRX_n 7SRX_p 8SRX_n 8SRX_p 9SRX_n 9SRX_p 10SRX_n 10SRX_p 11SRX_n 11SRX_p 12SRX_n 12SRX_p 13SRX_n 13SRX_p 14SRX_n 14SRX_p 15SRX_n 15SRX_p DAC_CLK_n DAC_CLK_p DAC_SYSREF_n DAC_SYSREF_p
component class AssemblyNote: ZZ1 ZZ2 ZZ3 ZZ4
differential pair LMK_CLKIN1: +LMK_CLKIN1_p -LMK_CLKIN1_n
differential pair LMK_CLKIN0: +LMK_CLKIN0_p -LMK_CLKIN0_n
differential pair LMX_SYSREFOUT0: +LMX_SYSREFOUT0_p -LMX_SYSREFOUT0_n
differential pair LMX_LOGICSYSREFOUT0: +LMX_LOGICSYSREFOUT0_p -LMX_LOGICSYSREFOUT0_n
differential pair LMX_LOGICCLK: +LMX_LOGICCLK_p -LMX_LOGICCLK_n
differential pair LMX_CLKOUT0: +LMX_CLKOUT0_p -LMX_CLKOUT0_n
differential pair SDCLKOUT3: +SDCLKOUT3_p -SDCLKOUT3_n
differential pair SDCLKOUT1: +SDCLKOUT1_p -SDCLKOUT1_n
differential pair DCLKOUT6: +DCLKOUT6_p -DCLKOUT6_n
differential pair DCLKOUT4: +DCLKOUT4_p -DCLKOUT4_n
differential pair DCLKOUT2: +DCLKOUT2_p -DCLKOUT2_n
differential pair LMX_LOGIC_SYSREF: +LMX_LOGIC_SYSREF_p -LMX_LOGIC_SYSREF_n
differential pair LMX_LOGIC_CLK: +LMX_LOGIC_CLK_p -LMX_LOGIC_CLK_n
differential pair LMX_DAC_SYSREF: +LMX_DAC_SYSREF_p -LMX_DAC_SYSREF_n
differential pair GBTCLK1_FMC: +GBTCLK1_FMC_p -GBTCLK1_FMC_n
differential pair GBTCLK0_FMC: +GBTCLK0_FMC_p -GBTCLK0_FMC_n
differential pair FPGA_SYSREF: +FPGA_SYSREF_p -FPGA_SYSREF_n
differential pair FPGA_CORECLK: +FPGA_CORECLK_p -FPGA_CORECLK_n
differential pair DAC_SYSREF: +DAC_SYSREF_p -DAC_SYSREF_n
differential pair DAC_CLK: +DAC_CLK_p -DAC_CLK_n
differential pair 15SRX: +15SRX_p -15SRX_n
differential pair 14SRX: +14SRX_p -14SRX_n
differential pair 13SRX: +13SRX_p -13SRX_n
differential pair 12SRX: +12SRX_p -12SRX_n
differential pair 11SRX: +11SRX_p -11SRX_n
differential pair 10SRX: +10SRX_p -10SRX_n
differential pair 9SRX: +9SRX_p -9SRX_n
differential pair 8SRX: +8SRX_p -8SRX_n
differential pair 7SRX: +7SRX_p -7SRX_n
differential pair 6SRX: +6SRX_p -6SRX_n
differential pair 5SRX: +5SRX_p -5SRX_n
differential pair 4SRX: +4SRX_p -4SRX_n
differential pair 3SRX: +3SRX_p -3SRX_n
differential pair 2SRX: +2SRX_p -2SRX_n
differential pair 1SRX: +1SRX_p -1SRX_n
differential pair 0SRX: +0SRX_p -0SRX_n

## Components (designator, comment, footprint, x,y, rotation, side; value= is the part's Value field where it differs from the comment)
C1 "C0805C105K5RACTU" 0805_HV 285,500.04 r180 bottom value=1uF
C2 "C2012X7R1H105K125AB" 0805L_cap 970.24,377.03 r270 bottom value="1 uF"
C3 "C2012X7R1H105K125AB" 0805L_cap 965.24,257.97 r90 bottom value="1 uF"
C4 "GRM155R61E104KA87D" 0402L 1143.45,399.15 r0 bottom value=0.1uF
C5 "CGA3E2X7R1H102K080AA" 0603L_cap 750,187.44 r90 bottom value="0.001 uF"
C6 "CGA3E2X7R1H102K080AA" 0603L_cap 800,168.66 r90 bottom value="0.001 uF"
C7 "08053D106KAT4A" 0805L_cap 80.83,1308.74 r90 top value="10 uF"
C8 "C1005X5R1A475K050BE" 0402L_cap 257.6,1328.42 r90 top value="4.7 uF"
C9 "08053D106KAT4A" 0805L_cap 80.83,1108.74 r90 top value="10 uF"
C10 "C1005X5R1A475K050BE" 0402L_cap 257.6,1128.42 r90 top value="4.7 uF"
C11 "1210YD476KAT2A" 1210L_cap 1733.62,2264.96 r270 top value="47 uF"
C12 "1210YD476KAT2A" 1210L_cap 2053.29,2094.85 r90 top value="47 uF"
C13 "0402ZC103MAT2A" 0402L_cap 1840.03,2257.68 r0 top value="0.01 uF"
C14 "0402ZC103MAT2A" 0402L_cap 2094.63,2211.15 r270 top value="0.01 uF"
C15 "08053D106KAT4A" 0805L_cap 1047.61,2514.32 r180 top value="10 uF"
C16 "04023C222JAT2A" 0402L_cap 1047.61,2463.32 r180 top value="2200 pF"
C17 "C2012X7S1A226M125AC" 0805L_cap 1237.89,2329.53 r90 top value="22 uF"
C18 "C2012X7S1A226M125AC" 0805L_cap 1307.2,2329.53 r90 top value="22 uF"
C19 "C2012X7S1A226M125AC" 0805L_cap 1237.89,2453.54 r270 top value="22 uF"
C20 "C2012X7S1A226M125AC" 0805L_cap 1385.94,2329.53 r90 top value="22 uF"
C21 "C2012X7S1A226M125AC" 0805L_cap 1629.88,2179.03 r90 top value="22 uF"
C22 "C2012X7S1A226M125AC" 0805L_cap 1629.88,2288.58 r270 top value="22 uF"
C23 "CGA2B2X7R1E223M050BA" 0402L_cap 899.32,2390.63 r0 top value="0.022 uF"
C24 "C2012X7S1A226M125AC" 0805L_cap 1629.88,2429.53 r90 top value="22 uF"
C25 "C2012X7S1A226M125AC" 0805L_cap 1699.88,2429.53 r90 top value="22 uF"
C26 "C1005X5R1A475K050BE" 0402L_cap 1939.53,2449.21 r90 top value="4.7 uF"
C27 "0402ZC103MAT2A" 0402L_cap 1688.49,2529.88 r270 top value="0.01 uF"
C28 "08053D106KAT4A" 0805L_cap 1017.06,2125.59 r180 top value="10 uF"
C29 "08053D106KAT4A" 0805L_cap 1031.91,1826.54 r180 top value="10 uF"
C30 "04023D104KAT2A" 0402L_cap 1017.06,2058.54 r180 top value="0.1 uF"
C31 "04023D104KAT2A" 0402L_cap 1017.06,1877.84 r180 top value="0.1 uF"
C32 "0201BB104KW160" 0201_cap 954.93,2048.95 r180 top value="0.1 uF"
C33 "C2012X7S1A226M125AC" 0805L_cap 1217.75,1818.66 r90 top value="22 uF"
C34 "C2012X7S1A226M125AC" 0805L_cap 1217.75,2117.72 r270 top value="22 uF"
C35 "1210YD476KAT2A" 1210L_cap 1317.75,2116.34 r270 top value="47 uF"
C36 "1210YD476KAT2A" 1210L_cap 1317.75,1820.04 r90 top value="47 uF"
C37 "GRM155R61E104KA87D" 0402L 1561.85,1806.37 r90 bottom value=0.1uF
C38 "C1005X5R1A225K050BC" 0402L_cap 921.27,1852.43 r0 top value="2.2 uF"
C39 "08053D106KAT4A" 0805L_cap 263.37,1039.68 r180 top value="10 uF"
C40 "04023C222JAT2A" 0402L_cap 263.37,988.68 r180 top value="2200 pF"
C41 "C2012X7S1A226M125AC" 0805L_cap 453.65,854.88 r90 top value="22 uF"
C42 "C2012X7S1A226M125AC" 0805L_cap 522.96,854.88 r90 top value="22 uF"
C43 "C2012X7S1A226M125AC" 0805L_cap 453.65,978.9 r270 top value="22 uF"
C44 "C2012X7S1A226M125AC" 0805L_cap 601.7,854.88 r90 top value="22 uF"
C45 "C2012X7S1A226M125AC" 0805L_cap 850.64,829.88 r90 top value="22 uF"
C46 "C2012X7S1A226M125AC" 0805L_cap 844.64,940.94 r270 top value="22 uF"
C47 "CGA2B2X7R1E223M050BA" 0402L_cap 115.08,915.98 r0 top value="0.022 uF"
C48 "GRM155R61E104KA87D" 0402L 1289.08,1066.41 r90 bottom value=0.1uF
C49 "04026D104KAT4A" 0402L_cap 811.87,1164.92 r270 top value="0.1 uF"
C50 "NFM18PC105R0J3D" NFM18PC 1723.37,1214.73 r0 top value="1 µF"
C51 "0603ZD106KAT2A" 0603L_cap 1082.11,1157.05 r270 top value="10 uF"
C52 "C1005X5R1E105K050BC" 0402L_cap 1343.13,1187.16 r270 top value="1 uF"
C53 "GRM188R61E106KA73J" 0603L_cap 1602.02,1212.16 r90 top value="10 uF"
C54 "GRT155R71E104KE01J" 0402L_cap 1652.02,1216.1 r90 top value="0.1 uF"
C55 "NFM18PC105R0J3D" NFM18PC 1723.37,1264.73 r0 top value="1 µF"
C56 "C1005X5R1E105K050BC" 0402L_cap 1037.11,1072.01 r90 top value="1 uF"
C57 "GRM188R61E106KA73J" 0603L_cap 1602.02,1314.53 r90 top value="10 uF"
C58 "GRT155R71E104KE01J" 0402L_cap 1652.02,1318.46 r90 top value="0.1 uF"
C59 "NFM18PC105R0J3D" NFM18PC 1723.37,1064.73 r0 top value="1 µF"
C60 "GRM188R61E106KA73J" 0603L_cap 1602.02,1109.8 r90 top value="10 uF"
C61 "GRT155R71E104KE01J" 0402L_cap 1652.02,1113.74 r90 top value="0.1 uF"
C62 "NFM18PC105R0J3D" NFM18PC 1723.37,1114.73 r0 top value="1 µF"
C63 "NFM18PC105R0J3D" NFM18PC 1723.37,1164.73 r0 top value="1 µF"
C64 "0201BB104KW160" 0201_cap 2374.73,1679.4 r270 top value="0.1 uF"
C65 "0201BB104KW160" 0201_cap 2363.71,1667.59 r0 top value="0.1 uF"
C66 "0201BB104KW160" 0201_cap 2363.71,1643.91 r0 top value="0.1 uF"
C67 "GRM155R61E104KA87D" 0402L 2752.17,1841.61 r270 top value=0.1uF
C68 "GRM155R61E104KA87D" 0402L 2673.43,1767.24 r90 bottom value=0.1uF
C69 "GRM155R61E104KA87D" 0402L 2575,1767.24 r90 bottom value=0.1uF
C70 "GRM155R61E104KA87D" 0402L 2431.3,1781.02 r270 bottom value=0.1uF
C71 "GRM155R61E104KA87D" 0402L 2450.99,1702.28 r180 bottom value=0.1uF
C72 "GRM155R61E104KA87D" 0402L 2450.99,1643.22 r180 bottom value=0.1uF
C73 "0201BB104KW160" 0201_cap 2999.81,1545.98 r270 top value="0.1 uF"
C74 "0201BB104KW160" 0201_cap 2999.81,1484.56 r90 top value="0.1 uF"
C75 "0201BB104KW160" 0201_cap 2988.78,1495.58 r180 top value="0.1 uF"
C76 "0201BB104KW160" 0201_cap 2988.78,1534.95 r180 top value="0.1 uF"
C77 "GRM155R61E104KA87D" 0402L 2376.62,1584.17 r0 top value=0.1uF
C78 "GRM155R61E104KA87D" 0402L 2376.62,1525.11 r0 top value=0.1uF
C79 "GRM155R61E104KA87D" 0402L 2376.62,1485.74 r0 top value=0.1uF
C80 "GRM155R61E104KA87D" 0402L 2535.63,1471.96 r270 bottom value=0.1uF
C81 "GRM155R61E104KA87D" 0402L 2757.09,1385.78 r90 top value=0.1uF
C82 "GRM155R61E104KA87D" 0402L 2832.44,1608.22 r180 top value=0.1uF
C83 "0201BB104KW160" 0201_cap 2374.73,1772.67 r270 top value="0.1 uF"
C84 "0201BB104KW160" 0201_cap 2628.11,1882.94 r270 top value="0.1 uF"
C85 "0201BB104KW160" 0201_cap 2604.92,1882.94 r270 top value="0.1 uF"
C86 "0201BB104KW160" 0201_cap 2545.08,1882.94 r270 top value="0.1 uF"
C87 "0201BB104KW160" 0201_cap 2521.9,1882.94 r270 top value="0.1 uF"
C88 "0201BB104KW160" 0201_cap 2363.71,1761.65 r0 top value="0.1 uF"
C89 "0201BB104KW160" 0201_cap 2363.71,1737.96 r0 top value="0.1 uF"
C90 "0201BB104KW160" 0201_cap 2531.97,1349.44 r90 top value="0.1 uF"
C91 "0201BB104KW160" 0201_cap 2554.93,1349.44 r90 top value="0.1 uF"
C92 "0201BB104KW160" 0201_cap 2614.77,1349.44 r90 top value="0.1 uF"
C93 "0201BB104KW160" 0201_cap 2637.72,1349.44 r90 top value="0.1 uF"
C94 "C1608X5R1A106K080AC" 0603L_cap 2760.2,1642.91 r0 bottom value="10 uF"
C95 "GRM155R61E104KA87D" 0402L 2758.07,1683.59 r0 bottom value=0.1uF
C96 "GRM155R61E104KA87D" 0402L 1175.66,1337.1 r0 bottom value=0.1uF
C97 "0603ZD106KAT2A" 0603L_cap 1376.37,1451.26 r90 top value="10 uF"
C98 "C1005X5R1A225K050BC" 0402L_cap 1331.37,1455.2 r90 top value="2.2 uF"
C99 "GRM033R61A105ME44D" 0201_cap 1187.56,1484.72 r90 top value="1 uF"
C100 "0603ZD106KAT2A" 0603L_cap 1365.81,1574.76 r180 top value="10 uF"
C101 "GRM188R61E106KA73J" 0603L_cap 1503.48,1630.32 r90 top value="10 uF"
C102 "GRT155R71E104KE01J" 0402L_cap 1455.48,1630.32 r90 top value="0.1 uF"
C103 "GRM033R61A105ME44D" 0201_cap 1175.54,1519.25 r0 top value="1 uF"
C104 "0603ZD106KAT2A" 0603L_cap 1364.83,1525.08 r180 top value="10 uF"
C105 "0603ZD106KAT2A" 0603L_cap 1640.98,1631.36 r270 top value="10 uF"
C106 "C1005X5R1A225K050BC" 0402L_cap 1685.98,1627.42 r270 top value="2.2 uF"
C107 "GRM033R61A105ME44D" 0201_cap 1829.79,1597.9 r270 top value="1 uF"
C108 "0603ZD106KAT2A" 0603L_cap 1651.53,1507.86 r0 top value="10 uF"
C109 "GRM188R61E106KA73J" 0603L_cap 1561.87,1452.3 r270 top value="10 uF"
C110 "GRT155R71E104KE01J" 0402L_cap 1513.87,1452.3 r270 top value="0.1 uF"
C111 "GRM033R61A105ME44D" 0201_cap 1841.42,1553.37 r180 top value="1 uF"
C112 "0603ZD106KAT2A" 0603L_cap 1652.52,1557.54 r0 top value="10 uF"
C113 "GRM155R61E104KA87D" 0402L 1385.57,606.41 r90 bottom value=0.1uF
C114 "04026D104KAT4A" 0402L_cap 908.37,704.92 r270 top value="0.1 uF"
C115 "NFM18PC105R0J3D" NFM18PC 1726.05,599.68 r270 top value="1 µF"
C116 "0603ZD106KAT2A" 0603L_cap 1178.61,697.05 r270 top value="10 uF"
C117 "C1005X5R1E105K050BC" 0402L_cap 1418.61,727.16 r270 top value="1 uF"
C118 "GRM188R61E106KA73J" 0603L_cap 1645.65,712.79 r270 top value="10 uF"
C119 "GRT155R71E104KE01J" 0402L_cap 1695.65,708.86 r270 top value="0.1 uF"
C120 "NFM18PC105R0J3D" NFM18PC 1668.86,599.68 r270 top value="1 µF"
C121 "C1005X5R1E105K050BC" 0402L_cap 1133.61,612.01 r90 top value="1 uF"
C122 "GRM155R61E104KA87D" 0402L 1383.57,854.41 r90 bottom value=0.1uF
C123 "04026D104KAT4A" 0402L_cap 908.37,954.92 r270 top value="0.1 uF"
C124 "0603ZD106KAT2A" 0603L_cap 1178.61,947.05 r270 top value="10 uF"
C125 "C1005X5R1E105K050BC" 0402L_cap 1418.61,977.16 r270 top value="1 uF"
C126 "GRM188R61E106KA73J" 0603L_cap 1645.65,891.93 r90 top value="10 uF"
C127 "GRT155R71E104KE01J" 0402L_cap 1695.65,895.87 r90 top value="0.1 uF"
C128 "C1005X5R1E105K050BC" 0402L_cap 1133.61,862.01 r90 top value="1 uF"
C129 "NFM15PC474R0J3D" NFM15PC 2424.57,1317.7 r270 top value=0.47uF
C130 "0201BB104KW160" 0201_cap 2981.41,1200.31 r0 bottom value="0.1 uF"
C131 "0201BB104KW160" 0201_cap 2703.78,1154.69 r0 top value="0.1 uF"
C132 "NFM15PC474R0J3D" NFM15PC 2066.19,1333.18 r0 top value=0.47uF
C133 "NFM15PC474R0J3D" NFM15PC 2077.72,1085.82 r0 top value=0.47uF
C134 "0201BB104KW160" 0201_cap 2999.81,1164.6 r90 top value="0.1 uF"
C135 "0201BB104KW160" 0201_cap 2999.81,1236.02 r270 top value="0.1 uF"
C136 "0201BB104KW160" 0201_cap 2320.45,776.02 r270 top value="0.1 uF"
C137 "NFM15PC474R0J3D" NFM15PC 2135.79,1456.7 r270 top value=0.47uF
C138 "0201BB104KW160" 0201_cap 2988.78,1175.62 r180 top value="0.1 uF"
C139 "0201BB104KW160" 0201_cap 2259.94,1130.82 r0 top value="0.1 uF"
C140 "0201BB104KW160" 0201_cap 2988.78,1224.99 r180 top value="0.1 uF"
C141 "0201BB104KW160" 0201_cap 2331.48,765 r180 top value="0.1 uF"
C142 "0201BB104KW160" 0201_cap 2271.75,1119.8 r270 top value="0.1 uF"
C143 "0201BB104KW160" 0201_cap 2495.83,1188.46 r180 top value="0.1 uF"
C144 "0201BB104KW160" 0201_cap 2495.83,1213.14 r180 top value="0.1 uF"
C145 "NFM15PC474R0J3D" NFM15PC 2077.72,1035.82 r0 top value=0.47uF
C146 "0402ZC103MAT2A" 0402L_cap 2432.44,1368.57 r180 top value="0.01 uF"
C147 "0603ZD106KAT2A" 0603L_cap 2086.19,1403.81 r0 top value="10 uF"
C148 "0201BB104KW160" 0201_cap 2111.39,1368.57 r180 top value="0.1 uF"
C149 "0201BB104KW160" 0201_cap 2378.52,765 r0 top value="0.1 uF"
C150 "0201BB104KW160" 0201_cap 2294.8,1119.8 r270 top value="0.1 uF"
C151 "0201BB104KW160" 0201_cap 2103.39,1250.46 r0 top value="0.1 uF"
C152 "0201BB104KW160" 0201_cap 2103.39,1275.15 r0 top value="0.1 uF"
C153 "0201BB104KW160" 0201_cap 2212.62,1500.19 r270 top value="0.1 uF"
C154 "02015C101KAT2A" 0201_cap 2238.67,1074.16 r90 bottom value="100 pF"
C155 "0201BB104KW160" 0201_cap 2235.81,1500.19 r270 top value="0.1 uF"
C156 "0201BB104KW160" 0201_cap 2291.36,1500.19 r270 top value="0.1 uF"
C157 "0201BB104KW160" 0201_cap 2314.55,1500.19 r270 top value="0.1 uF"
C158 "02015C101KAT2A" 0201_cap 2146.4,1076.16 r90 top value="100 pF"
C159 "GRM155R61E104KA87D" 0402L 1021,1333.79 r270 bottom value=0.1uF
C160 "GRM155R61E104KA87D" 0402L 1049.48,1426.85 r270 bottom value=0.1uF
C161 "GRM155R61E104KA87D" 0402L 550.88,682.33 r180 bottom value=0.1uF
C162 "GRM155R61E104KA87D" 0402L 961,1498.79 r270 bottom value=0.1uF
C163 "GRM155R61E104KA87D" 0402L 752.57,1678.22 r90 bottom value=0.1uF
C164 "GRM155R61E104KA87D" 0402L 787.57,1668.22 r270 bottom value=0.1uF
C165 "GRM155R61E104KA87D" 0402L 901,1663.79 r270 bottom value=0.1uF
C166 "GRM155R61E104KA87D" 0402L 750.54,1843.89 r90 bottom value=0.1uF
C167 "GRM155R61E104KA87D" 0402L 800.02,1844.1 r90 bottom value=0.1uF
C168 "GRM155R61E104KA87D" 0402L 618.06,1772.05 r270 bottom value=0.1uF
C169 "GRM155R61E104KA87D" 0402L 821,1411.29 r270 bottom value=0.1uF
C170 "GRM155R61E104KA87D" 0402L 639.08,1877.52 r270 bottom value=0.1uF
C171 "GRM155R61E104KA87D" 0402L 1372.23,379.27 r90 bottom value=0.1uF
C172 "GRM155R61E104KA87D" 0402L 1409.63,266.28 r270 bottom value=0.1uF
C173 "0201BB104KW160" 0201_cap 3099.18,1357.79 r270 bottom value="0.1 uF"
C174 "08053D106KAT4A" 0805L_cap 526.97,2345.3 r180 bottom value="10 uF"
C175 "04023C222JAT2A" 0402L_cap 526.97,2396.3 r180 bottom value="2200 pF"
C176 "C2012X7S1A226M125AC" 0805L_cap 717.24,2530.09 r270 bottom value="22 uF"
C177 "C2012X7S1A226M125AC" 0805L_cap 786.56,2530.09 r270 bottom value="22 uF"
C178 "C2012X7S1A226M125AC" 0805L_cap 865.3,2530.09 r270 bottom value="22 uF"
C179 "C2012X7S1A226M125AC" 0805L_cap 717.24,2350.21 r90 bottom value="22 uF"
C180 "CGA2B2X7R1E223M050BA" 0402L_cap 378.68,2468.99 r0 bottom value="0.022 uF"
C181 "CL10A226MP8NUNE" 0603L 2176.23,2551.7 r90 bottom value=22uF
C182 "C1005X7S1A225K050BC" 0402_065L 2218.99,2547.76 r90 bottom value=2.2uF
C183 "C0402C103K4RACTU" 0402 2405.95,2481.82 r90 bottom value=0.01uF
C184 "CL10A226MP8NUNE" 0603L 2517.9,2542.05 r90 bottom value=22uF
C185 "C1005X7S1A225K050BC" 0402_065L 2561.33,2538.02 r90 bottom value=2.2uF
C186 "CL10A226MP8NUNE" 0603L 2573.15,2616.53 r180 bottom value=22uF
C187 "C1005X7S1A225K050BC" 0402_065L 2677.77,2639.14 r90 bottom value=2.2uF
C188 "C0402C103K4RACTU" 0402 2196.23,2436.95 r90 top value=0.01uF
C189 "C1005X7S1A225K050BC" 0402_065L 3077.33,259.97 r270 top value=2.2uF
C190 "0201BB104KW160" 0201_cap 3363.74,1137.25 r0 bottom value="0.1 uF"
C191 "0201BB104KW160" 0201_cap 3540.04,1133.46 r135 bottom value="0.1 uF"
C192 "0201BB104KW160" 0201_cap 3422.74,1270.39 r270 bottom value="0.1 uF"
C193 "0201BB104KW160" 0201_cap 3453.51,1279.05 r90 bottom value="0.1 uF"
C194 "0201BB104KW160" 0201_cap 3394.45,1377.47 r0 bottom value="0.1 uF"
C195 "0201BB104KW160" 0201_cap 3433.82,1495.58 r0 bottom value="0.1 uF"
C196 "0201BB104KW160" 0201_cap 3335.4,1475.9 r270 bottom value="0.1 uF"
C197 "0201BB104KW160" 0201_cap 3571.62,1515.27 r90 bottom value="0.1 uF"
C198 "0201BB104KW160" 0201_cap 3513.45,1561.53 r45 bottom value="0.1 uF"
C199 "0201BB104KW160" 0201_cap 3433.82,1574.32 r180 bottom value="0.1 uF"
C200 "0201BB104KW160" 0201_cap 3328.4,1279.05 r270 bottom value="0.1 uF"
C201 "0201BB104KW160" 0201_cap 3355.08,1304.73 r0 bottom value="0.1 uF"
C202 "0201BB104KW160" 0201_cap 3473.19,1377.47 r0 bottom value="0.1 uF"
C203 "0201BB104KW160" 0201_cap 3433.82,1416.84 r0 bottom value="0.1 uF"
C204 "0201BB104KW160" 0201_cap 3355.08,1397.16 r45 bottom value="0.1 uF"
C205 "0201BB104KW160" 0201_cap 3355.08,1515.27 r315 bottom value="0.1 uF"
C206 "0201BB104KW160" 0201_cap 3571.62,1318.42 r270 bottom value="0.1 uF"
C207 "0201BB104KW160" 0201_cap 3571.62,1239.68 r90 bottom value="0.1 uF"
C208 "0201BB104KW160" 0201_cap 3473.19,1141.25 r0 bottom value="0.1 uF"
C209 "0201BB104KW160" 0201_cap 3571.62,1397.16 r90 bottom value="0.1 uF"
C210 "0201BB104KW160" 0201_cap 3433.82,1141.25 r180 bottom value="0.1 uF"
C211 "0201BB104KW160" 0201_cap 3573.62,1130.23 r90 bottom value="0.1 uF"
C212 "0201BB104KW160" 0201_cap 3571.62,1200.31 r270 bottom value="0.1 uF"
C213 "0201BB104KW160" 0201_cap 3158.23,1574.32 r180 bottom value="0.1 uF"
C214 "0201BB104KW160" 0201_cap 3158.23,1534.95 r180 bottom value="0.1 uF"
C215 "0201BB104KW160" 0201_cap 3236.97,1515.27 r315 bottom value="0.1 uF"
C216 "0201BB104KW160" 0201_cap 3276.34,1534.95 r0 bottom value="0.1 uF"
C217 "0201BB104KW160" 0201_cap 3256.66,1594.01 r90 bottom value="0.1 uF"
C218 "0201BB104KW160" 0201_cap 3217.29,1594.01 r90 bottom value="0.1 uF"
C219 "0201BB104KW160" 0201_cap 3217.29,1239.68 r270 bottom value="0.1 uF"
C220 "0201BB104KW160" 0201_cap 3256.66,1239.68 r90 bottom value="0.1 uF"
C221 "0201BB104KW160" 0201_cap 3256.66,1318.42 r90 bottom value="0.1 uF"
C222 "0201BB104KW160" 0201_cap 3256.66,1397.16 r270 bottom value="0.1 uF"
C223 "0201BB104KW160" 0201_cap 3236.97,1456.21 r0 bottom value="0.1 uF"
C224 "0201BB104KW160" 0201_cap 3197.6,1495.58 r0 bottom value="0.1 uF"
C225 "0201BB104KW160" 0201_cap 3217.29,1318.42 r90 bottom value="0.1 uF"
C226 "0201BB104KW160" 0201_cap 3177.92,1318.42 r90 bottom value="0.1 uF"
C227 "0201BB104KW160" 0201_cap 3391.56,1282.16 r225 bottom value="0.1 uF"
C228 "0201BB104KW160" 0201_cap 3394.45,1338.1 r0 bottom value="0.1 uF"
C229 "0201BB104KW160" 0201_cap 3473.19,1338.1 r0 bottom value="0.1 uF"
C230 "0201BB104KW160" 0201_cap 3433.82,1456.21 r180 bottom value="0.1 uF"
C231 "0201BB104KW160" 0201_cap 3355.08,1436.53 r45 bottom value="0.1 uF"
C232 "0201BB104KW160" 0201_cap 3394.45,1534.95 r0 bottom value="0.1 uF"
C233 "0201BB104KW160" 0201_cap 3571.62,1594.01 r270 bottom value="0.1 uF"
C234 "0201BB104KW160" 0201_cap 3473.19,1574.32 r0 bottom value="0.1 uF"
C235 "0201BB104KW160" 0201_cap 3355.08,1574.32 r0 bottom value="0.1 uF"
C236 "0201BB104KW160" 0201_cap 3177.92,1121.57 r270 bottom value="0.1 uF"
C237 "0201BB104KW160" 0201_cap 3197.6,1200.31 r135 bottom value="0.1 uF"
C238 "0201BB104KW160" 0201_cap 3158.23,1180.62 r180 bottom value="0.1 uF"
C239 "0201BB104KW160" 0201_cap 3217.29,1121.57 r270 bottom value="0.1 uF"
C240 "0201BB104KW160" 0201_cap 3276.34,1141.25 r0 bottom value="0.1 uF"
C241 "0201BB104KW160" 0201_cap 3276.34,1180.62 r0 bottom value="0.1 uF"
C242 "0201BB104KW160" 0201_cap 3296.03,1239.68 r90 bottom value="0.1 uF"
C243 "0201BB104KW160" 0201_cap 3296.03,1318.42 r90 bottom value="0.1 uF"
C244 "0201BB104KW160" 0201_cap 3296.03,1397.16 r270 bottom value="0.1 uF"
C245 "0201BB104KW160" 0201_cap 3296.03,1475.9 r270 bottom value="0.1 uF"
C246 "0201BB104KW160" 0201_cap 3217.29,1397.16 r270 bottom value="0.1 uF"
C247 "0201BB104KW160" 0201_cap 3177.92,1397.16 r270 bottom value="0.1 uF"
C248 "0201BB104KW160" 0201_cap 3138.55,1279.05 r90 bottom value="0.1 uF"
C249 "0201BB104KW160" 0201_cap 3118.86,1318.42 r45 bottom value="0.1 uF"
C250 "0201BB104KW160" 0201_cap 3118.86,1397.16 r315 bottom value="0.1 uF"
C251 "0201BB104KW160" 0201_cap 3138.55,1436.53 r270 bottom value="0.1 uF"
C252 "NFM15PC474R0J3D" NFM15PC 3747.18,1614.22 r180 top value=0.47uF
C253 "NFM15PC474R0J3D" NFM15PC 3735.31,1028.04 r180 top value=0.47uF
C254 "NFM15PC474R0J3D" NFM15PC 3747.18,1653.9 r180 top value=0.47uF
C255 "NFM15PC474R0J3D" NFM15PC 3740.61,1211.1 r180 top value=0.47uF
C256 "0201BB104KW160" 0201_cap 3335.4,1169.6 r90 bottom value="0.1 uF"
C257 "0201BB104KW160" 0201_cap 3317.71,1202.31 r45 bottom value="0.1 uF"
C258 "0201BB104KW160" 0201_cap 3512.56,1495.58 r0 bottom value="0.1 uF"
C259 "0201BB104KW160" 0201_cap 3512.56,1416.84 r0 bottom value="0.1 uF"
C260 "0201BB104KW160" 0201_cap 3512.56,1456.21 r0 bottom value="0.1 uF"
C261 "0201BB104KW160" 0201_cap 3512.56,1529.45 r0 bottom value="0.1 uF"
C262 "GRM155R61E104KA87D" 0402L 4334.92,209.51 r180 bottom value=0.1uF
C263 "LMK063BJ224MP-F" 0201_033L 3103.04,267.82 r270 top value=0.22uF
C264 "CL10A226MP8NUNE" 0603L 2972.28,2460.34 r0 bottom value=22uF
C265 "0201BB104KW160" 0201_cap 3187.76,210.06 r90 top value="0.1 uF"
C266 "0201BB104KW160" 0201_cap 3208.23,428.69 r90 top value="0.1 uF"
C267 "0.5 pF" CAPC0603X28X15NL05T05 3197.6,640.51 r0 top
C268 "0.5 pF" CAPC0603X28X15NL05T05 3197.6,617.73 r0 top
C269 "0.8 pF" CAPC0603X28X15LL05T05 3197.6,550.12 r0 top
C270 "0.5 pF" CAPC0603X28X15NL05T05 3197.6,483.7 r0 top
C271 "0.5 pF" CAPC0603X28X15NL05T05 3197.6,462.1 r0 top
C272 "0.8 pF" CAPC0603X28X15LL05T05 3208.63,2131.65 r270 top
C273 "0201BB104KW160" 0201_cap 3186.97,428.69 r90 top value="0.1 uF"
C274 "C1005X7S1A225K050BC" 0402_065L 2969.4,2413.53 r0 bottom value=2.2uF
C275 "C1005X7S1A225K050BC" 0402_065L 3321.15,2456.42 r90 top value=2.2uF
C276 "LMK063BJ224MP-F" 0201_033L 3294.45,2448.06 r90 top value=0.22uF
C278 "0201BB104KW160" 0201_cap 3207.44,2505.51 r270 top value="0.1 uF"
C279 "0201BB104KW160" 0201_cap 3208.23,2286.88 r270 top value="0.1 uF"
C280 "0.5 pF" CAPC0603X28X15NL05T05 3197.6,2097.84 r0 top
C281 "0.8 pF" CAPC0603X28X15LL05T05 3197.6,2165.45 r0 top
C282 "0.5 pF" CAPC0603X28X15NL05T05 3197.6,2231.88 r0 top
C283 "0.8 pF" CAPC0603X28X15LL05T05 3186.58,2131.65 r270 top
C286 "0201BB104KW160" 0201_cap 3186.97,2286.88 r270 top value="0.1 uF"
D1 "MBR130T1G" SOD-123 1040.24,182.76 r270 bottom value=30V
D2 "SMBJ15CA" SMB-Bi 284.99,675.04 r0 bottom value=15V
D3 "LTST-C191TGKT" LED_LTST-C190-Green 397.23,121.1 r90 top
F1 "SF-1206FP250-2" SF-1206F500M-2_1206 835.43,418.25 r180 bottom
FB1 "BLE18PS080SN1D" 0603L 1346.57,2411.13 r0 top value=-
FB2 "BLE18PS080SN1D" 0603L 562.33,936.49 r0 top value=-
FB3 "BLM18PG300SN1D" 0603L 1309.67,1130.47 r0 top value=-
FB4 "BLM18PG300SN1D" 0603L 1385.14,670.47 r0 top value=-
FB5 "BLM18PG300SN1D" 0603L 1385.14,920.47 r0 top value=-
FB6 "BLE18PS080SN1D" 0603L 793.81,2407.29 r270 bottom value=-
FB7 "BLE18PS080SN1D" 0603L 2600.7,2541.89 r90 bottom value=-
FB8 "BLE18PS080SN1D" 0603L 3012.06,279.66 r0 top value=-
FB9 "BLE18PS080SN1D" 0603L 3398.39,2436.54 r180 top value=-
FB10 "BLE18PS080SN1D" 0603L 2876.77,2490.1 r270 bottom value=-
FC1 "FeedThruCap" NFM31PC#1 1509.99,2234.06 r0 top value=27uF
FC2 "FeedThruCap" NFM31PC#1 1509.99,2484.06 r0 top value=27uF
FC3 "FeedThruCap" NFM31PC#1 723.64,884.41 r0 top value=27uF
FC4 "FeedThruCap" NFM31PC#2 1486.08,1231.85 r0 top value=27uF
FC5 "FeedThruCap" NFM31PC#3 1486.08,1334.21 r0 top value=27uF
FC6 "FeedThruCap" NFM31PC#4 1486.08,1129.49 r0 top value=27uF
FC7 "FeedThruCap" NFM31PC#1 1346.48,1657.88 r0 top value=27uF
FC8 "FeedThruCap" NFM31PC#1 1670.87,1424.74 r180 top value=27uF
FC9 "FeedThruCap" NFM31PC#1 1528.65,677.36 r0 top value=27uF
FC10 "FeedThruCap" NFM31PC#1 1528.65,927.36 r0 top value=27uF
FC11 "FeedThruCap" NFM31PC#5 2687.07,2370.95 r90 bottom value=27uF
FC12 "FeedThruCap" NFM31PC#5 2058.38,2539.89 r0 bottom value=27uF
FC13 "FeedThruCap" NFM31PC#5 2686.69,2502.49 r270 bottom value=27uF
FC14 "FeedThruCap" NFM31PC#6 2876.77,2338.36 r180 bottom value=27uF
FID1 "Fiducial Mark" Fiducial10-20 4461.81,100 r0 top
FID2 "Fiducial Mark" Fiducial10-20 4461.81,2616.54 r90 top
FID3 "Fiducial Mark" Fiducial10-20 300,2616.54 r90 top
fid4 "Fiducial Mark" Fiducial10-20 299.41,2616.46 r180 bottom (schematic designator FID4)
fid5 "Fiducial Mark" Fiducial10-20 4461.81,2616.54 r180 bottom (schematic designator FID5)
fid6 "Fiducial Mark" Fiducial10-20 4461.81,100 r180 bottom (schematic designator FID6)
H3 "2069-440-SS" FP-2116-440-AL_STANDOFF_HEX_1-4-MFG 150,2566.54 r0 top
H4 "2069-440-SS" FP-2116-440-AL_STANDOFF_HEX_1-4-MFG 150,150 r0 top
J1 "ASP-184330-01" SAMTEC_ASP-184330-01 4147.81,1358.06 r90 top
J2 "RAPC722X" RAPC722X -150.83,495.04 r0 top
J3 "22-23-2021" Molex_22-23-2021 549.34,1229.21 r0 top
J4 "132134-15" FP-132134-15_CONN_SMA_JACK-MFG 2020,1720.62 r0 top
J5 "132134-15" FP-132134-15_CONN_SMA_JACK-MFG 2434.73,2133.69 r0 top
J6 "QSH-030-01-L-D-A" FTDI_Dongle_004 -262.8,1948.31 r0 top
J7 "132134-15" FP-132134-15_CONN_SMA_JACK-MFG 2130,765 r0 top
J8 "132134-15" FP-132134-15_CONN_SMA_JACK-MFG 2580,765 r0 top
J9 "0853050232" Molex_0853050232 2042.37,1250.46 r270 top
J10 "132134-15" FP-132134-15_CONN_SMA_JACK-MFG 1680,315 r0 top
J11 "132134-15" FP-132134-15_CONN_SMA_JACK-MFG 2130,315 r0 top
J12 "PBC02SAAN" PBC02SAAN 1048.12,2631.37 r90 top
J13 "TSW-103-07-G-S" TSW-103-07-X-S 3449.32,401.28 r0 top
J14 "PBC02SAAN" PBC02SAAN 2910.53,400.33 r270 top
J15 "145-0701-802" Cinch_145-0701-802 3187.76,-0.17 r180 top
J16 "PBC02SAAN" PBC02SAAN 2787.52,2600.13 r180 top
J17 "TSW-103-07-G-S" TSW-103-07-X-S 2871.57,2198.8 r180 top
J18 "PBC02SAAN" PBC02SAAN 3433.82,2311.99 r90 top
J19 "145-0701-802" Cinch_145-0701-802 3207.44,2716.53 r0 top
L1 "XGL4020-152MEC" XGL4020 1171.1,1968.19 r0 top value="1.5 µH"
L3 "2 nH" FP-LQP03HQ_02-MFG 3208.63,583.93 r270 top
L4 "2 nH" FP-LQP03HQ_02-MFG 3208.23,516.72 r270 top
L5 "2 nH" FP-LQP03HQ_02-MFG 3186.58,583.93 r270 top
L6 "2 nH" FP-LQP03HQ_02-MFG 3186.97,516.72 r270 top
L7 "2 nH" FP-LQP03HQ_02-MFG 3208.23,2198.86 r90 top
L8 "2 nH" FP-LQP03HQ_02-MFG 3197.6,2075.07 r0 top
L9 "2 nH" FP-LQP03HQ_02-MFG 3197.6,2253.47 r0 top
L10 "2 nH" FP-LQP03HQ_02-MFG 3186.97,2198.86 r90 top
LBL1 "THT-14-423-10" Label_650x200 4405,1310 r90 top
Logo1 "FDL Logo" FDL_Small 630.57,2125.5 r0 top
LOGO2 "CAUTION HOT SURFACE" IEC_HotSurface_Small 4197,1765 r0 top
Logo3 "FCC disclaimer" FCC_disclaimer_stacked 1709.3,2582.7 r180 bottom
Logo4 "ESD Overlay" ESD_Overlay_Medium 4013,1520 r0 top
Logo5 "WEEE" WEEE_Minimum 1176.96,2441.22 r180 bottom
LOGO6 "CE Mark" CE_Mark_5mm 1739.37,2417.54 r180 bottom
Logo7 "Texas Instruments" TI_Stacked_Overlay_Small 4135,2002 r0 top
MP1 "ATS-54170R-C1-R0" ATS-54170R-C1-R0_BGA_HEATSINK_17p0x17p0mm 5699,1606.39 r0 top
MP5 "Fan" F17HA-05HC_FAN_17p0x17p0mm 4961,1596.39 r0 top
PP1 "Probe Point" ProbePoint_TH_40mil 1506.36,2357.66 r0 top
PP2 "Probe Point" ProbePoint_TH_40mil 1432.85,2062.07 r0 top
PP3 "Probe Point" ProbePoint_TH_40mil 647.7,959.41 r0 top
PP4 "Probe Point" ProbePoint_TH_40mil 1362.22,1080.47 r0 top
PP5 "Probe Point" ProbePoint_TH_40mil 2802.76,834.2 r0 top
PP6 "Probe Point" ProbePoint_TH_40mil 3605.6,1835.45 r0 top
PP7 "Probe Point" ProbePoint_TH_40mil 3741.9,1334.58 r0 top
PP8 "Probe Point" ProbePoint_TH_40mil 2910.53,1375.69 r0 top
PP9 "Probe Point" ProbePoint_TH_40mil 3605.6,1785.45 r0 top
PP10 "Probe Point" ProbePoint_TH_40mil 2906.52,1593.76 r90 top
PP11 "Probe Point" ProbePoint_TH_40mil 1638.38,1709.46 r90 top
PP12 "Probe Point" ProbePoint_TH_40mil 1493.49,1527.22 r90 top
PP13 "Probe Point" ProbePoint_TH_40mil 1462.7,752.36 r0 top
PP14 "Probe Point" ProbePoint_TH_40mil 1786.05,548.18 r0 top
PP15 "Probe Point" ProbePoint_TH_40mil 1608.86,548.18 r0 top
PP16 "Probe Point" ProbePoint_TH_40mil 1422.7,870.47 r90 top
PP17 "Probe Point" ProbePoint_TH_40mil 2052.92,1131.09 r90 top
PP18 "Probe Point" ProbePoint_TH_40mil 2052.92,1186.09 r90 top
PP19 "Probe Point" ProbePoint_TH_40mil 2451.89,1065.5 r90 top
PP20 "Probe Point" ProbePoint_TH_40mil 2501.89,1065.5 r0 top
PP21 "Probe Point" ProbePoint_TH_40mil 2401.89,1065.5 r0 top
PP22 "Probe Point" ProbePoint_TH_40mil 2551.89,1065.5 r0 top
PP23 "Probe Point" ProbePoint_TH_40mil 683.56,715.57 r0 top
PP24 "Probe Point" ProbePoint_TH_40mil 683.56,649.08 r0 top
PP25 "Probe Point" ProbePoint_TH_40mil 2773.51,1946.36 r90 top
PP26 "Probe Point" ProbePoint_TH_40mil 2472.23,414.83 r0 top
PP27 "Probe Point" ProbePoint_TH_40mil 2723.51,1946.36 r90 top
PP28 "Probe Point" ProbePoint_TH_40mil 2472.23,464.83 r0 top
PP29 "Probe Point" ProbePoint_TH_40mil 2823.51,1946.36 r90 top
PP30 "Probe Point" ProbePoint_TH_40mil 2472.23,514.83 r0 top
PP31 "Probe Point" ProbePoint_TH_40mil 2873.51,1946.36 r90 top
PP32 "Probe Point" ProbePoint_TH_40mil 2472.23,264.83 r0 top
PP33 "Probe Point" ProbePoint_TH_40mil 2472.23,314.83 r0 top
PP34 "Probe Point" ProbePoint_TH_40mil 2472.23,364.83 r0 top
PP35 "Probe Point" ProbePoint_TH_40mil 2864.85,1039.47 r0 top
PP36 "Probe Point" ProbePoint_TH_40mil 2864.85,989.47 r0 top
